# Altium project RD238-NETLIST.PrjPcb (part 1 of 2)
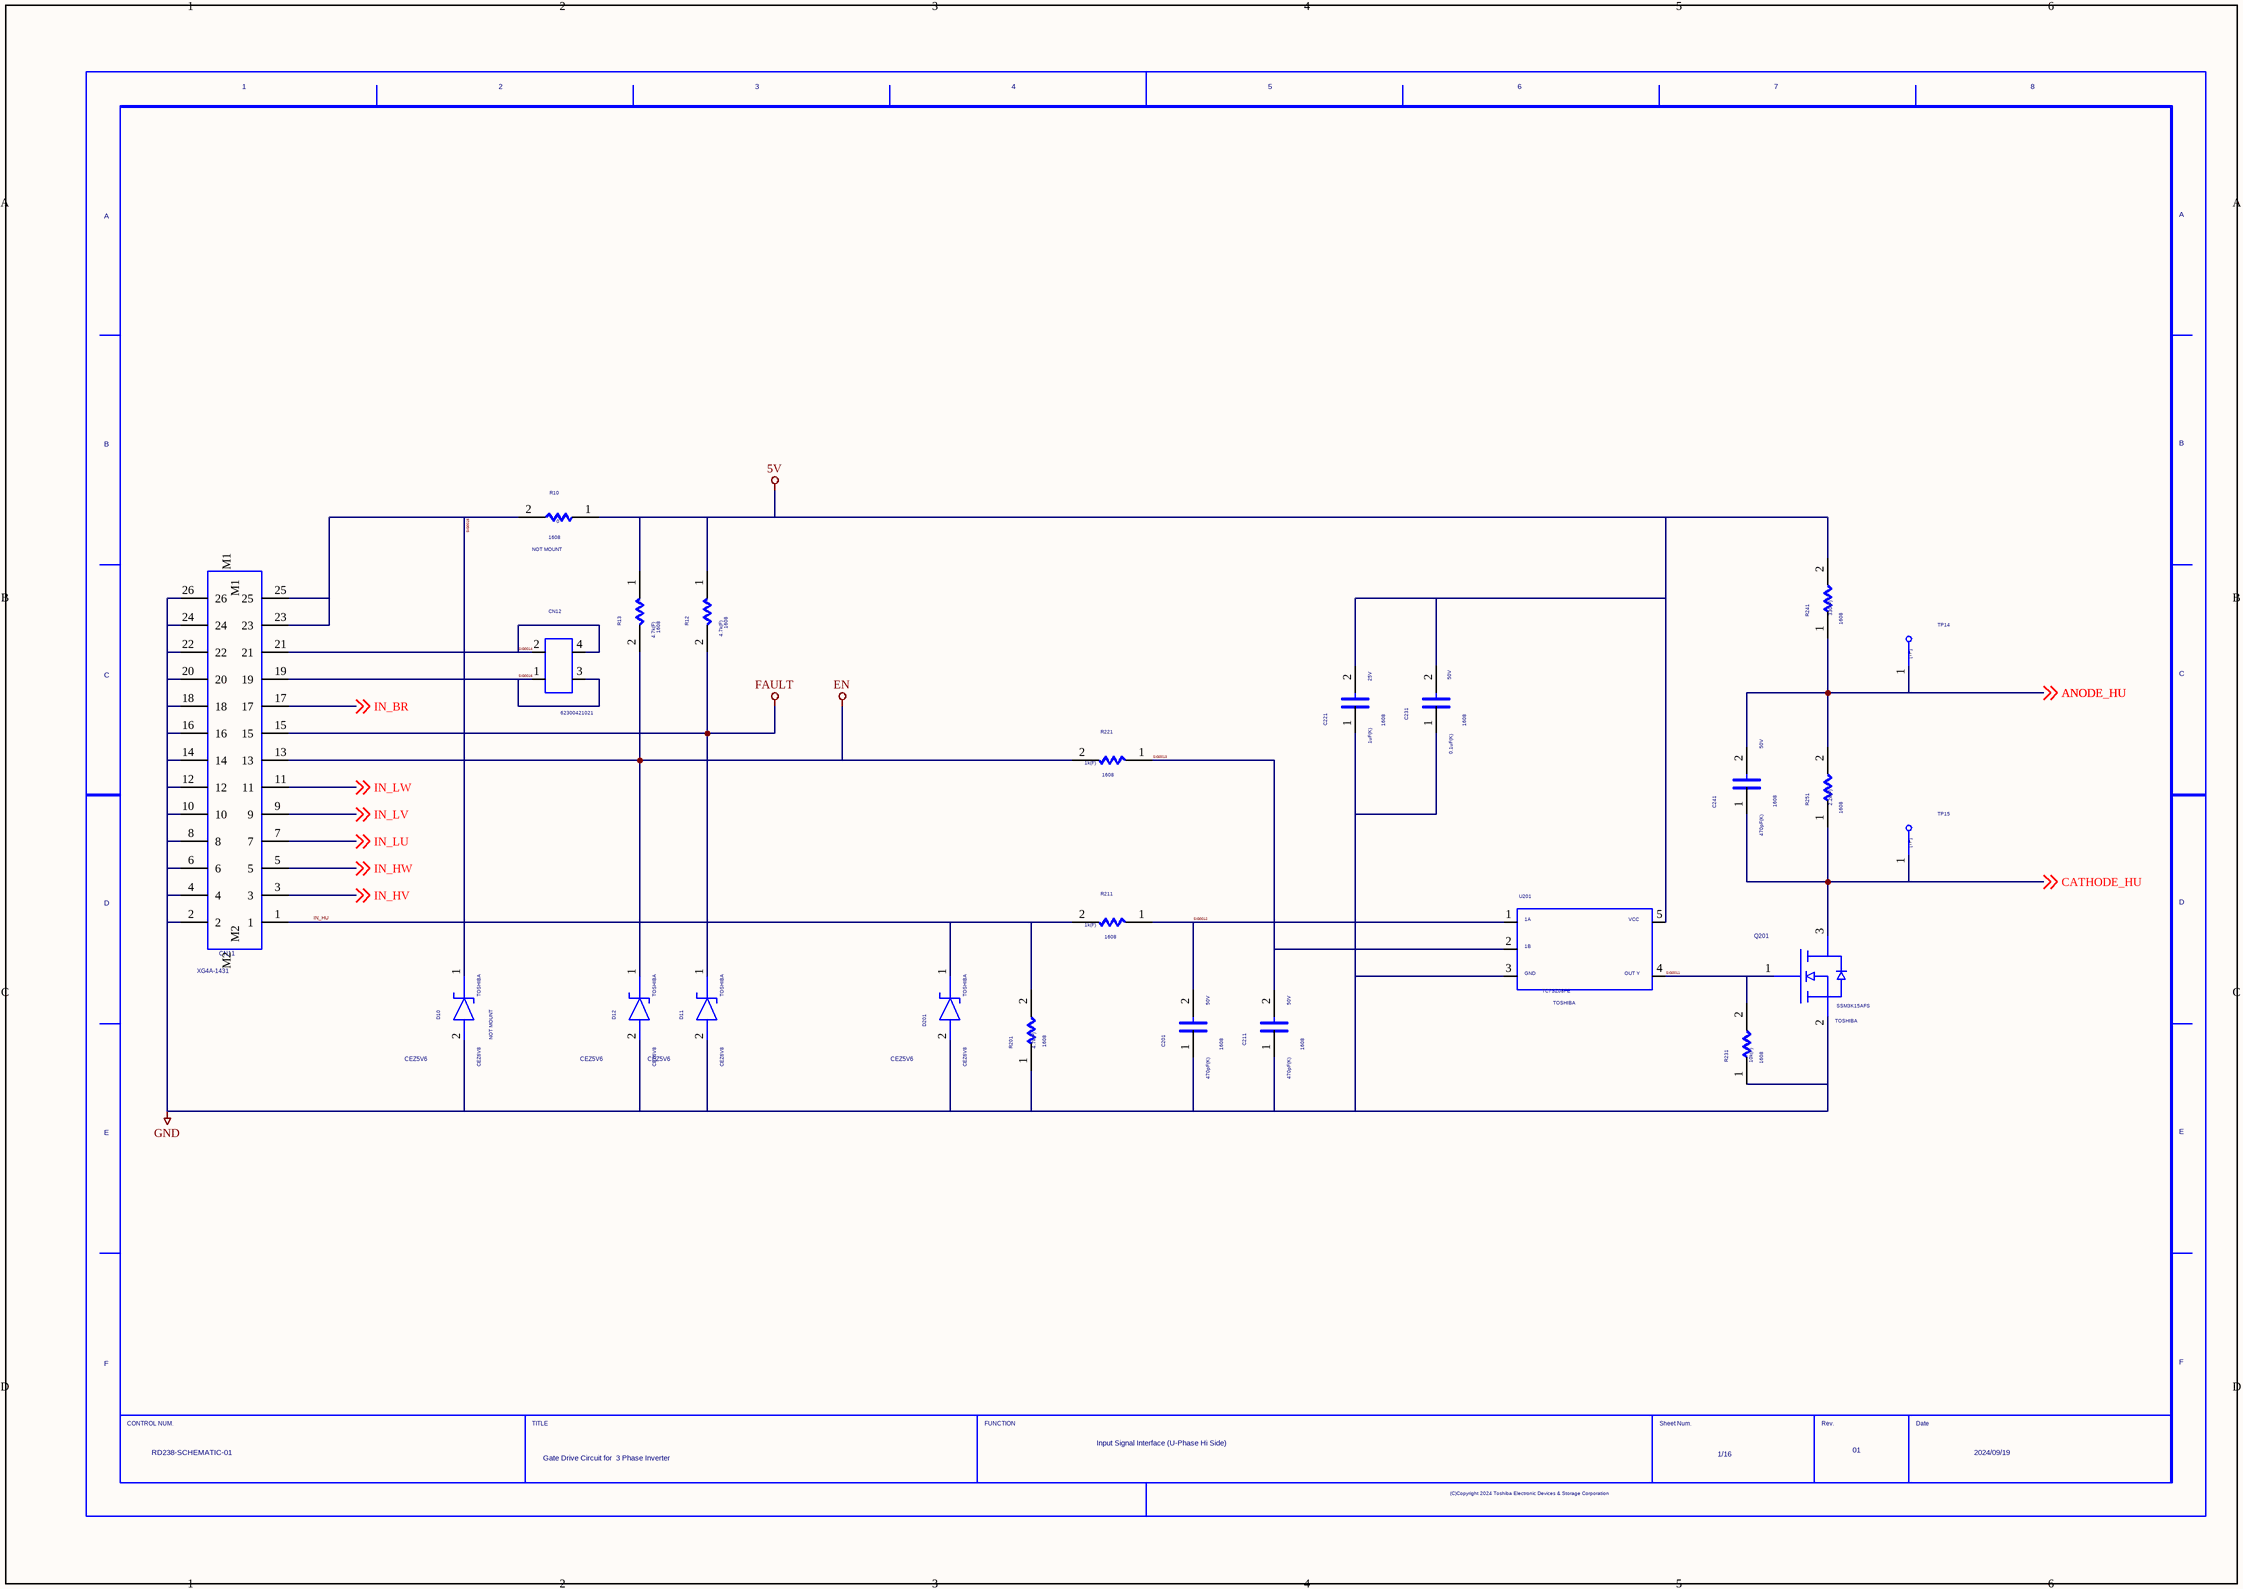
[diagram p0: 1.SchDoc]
16 sheets, 444 parts. Net scope: global (net labels, ports and power ports of the same name join across sheets).
Sheets:
  1.SchDoc
  2.SchDoc
  3.SchDoc
  4.SchDoc
  5.SchDoc
  6.SchDoc
  7.SchDoc
  8.SchDoc
  9.SchDoc
  10.SchDoc
  11.SchDoc
  12.SchDoc
  13.SchDoc
  14.SchDoc
  15.SchDoc
  16.SchDoc

## Sheet 1.SchDoc
size 420 x 297 mm

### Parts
(Parts that share a designator on the sheet are numbered #1, #2 ... from top to bottom, then left to right.)
C201  VAL1: 470pF(K)  VAL2: 50V  SIZECODESMD: 1608  (hidden comment: C)
C211  VAL1: 470pF(K)  VAL2: 50V  SIZECODESMD: 1608  (hidden comment: C)
C221  VAL1: 1uF(K)  VAL2: 25V  SIZECODESMD: 1608  (hidden comment: C)
C231  VAL1: 0.1uF(K)  VAL2: 50V  SIZECODESMD: 1608  (hidden comment: C)
C241  VAL1: 470pF(K)  VAL2: 50V  SIZECODESMD: 1608  (hidden comment: C)
CN11  XG4A-1431
CN12  VAL3: 62300421021  (hidden comment: TCR1HF50B)
D10  CEZ5V6  NOTMOUNT: NOT MOUNT  USERCOMPTEXT3: TOSHIBA  VAL3: CEZ6V8
D11  CEZ5V6  USERCOMPTEXT3: TOSHIBA  VAL3: CEZ6V8
D12  CEZ5V6  USERCOMPTEXT3: TOSHIBA  VAL3: CEZ6V8
D201  CEZ5V6  USERCOMPTEXT3: TOSHIBA  VAL3: CEZ6V8
Q201  USERCOMPTEXT3: TOSHIBA  VAL3: SSM3K15AFS  (hidden comment: SSM3K318R)
R10  NOTMOUNT: NOT MOUNT  VAL1: 0  SIZECODESMD: 1608  (hidden comment: R)
R12  VAL1: 4.7k(F)  SIZECODESMD: 1608  (hidden comment: R)
R13  VAL1: 4.7k(F)  SIZECODESMD: 1608  (hidden comment: R)
R201  VAL1: 4.7k(F)  SIZECODESMD: 1608  (hidden comment: R)
R211  VAL1: 1k(F)  SIZECODESMD: 1608  (hidden comment: R)
R221  VAL1: 1k(F)  SIZECODESMD: 1608  (hidden comment: R)
R231  VAL1: 10k(F)  SIZECODESMD: 1608  (hidden comment: R)
R241  VAL1: 330(F)  SIZECODESMD: 1608  (hidden comment: R)
R251  VAL1: 2.2k(F)  SIZECODESMD: 1608  (hidden comment: R)
TP14  TP  (value not drawn)
TP15  TP  (value not drawn)
U201  USERCOMPTEXT3: TOSHIBA  (hidden comment: TCR1HF50B)
U?#1  DATE: 2024/09/19  DRAWINGNUMBER: RD238-SCHEMATIC-01  TITLE: Gate Drive Circuit for / 3 Phase Inverter  FUNCTION: Input Signal Interface / (U-Phase Hi Side)  SHEETNUMBER: 1/16  REVISION: 01  (hidden comment: WAKU_DEF100)

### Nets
5V: C221.2 C231.2 R10.1 R12.1 R13.1 R241.2 U201.5
EN: CN11.13 D12.1(CATHODE) R13.2 R221.2
FAULT: CN11.15 D11.1(CATHODE) R12.2
GND: C201.1 C211.1 C221.1 C231.1 CN11.2 CN11.4 CN11.6 CN11.8 CN11.10 CN11.12 CN11.14 CN11.16 CN11.18 CN11.20 CN11.22 CN11.24 CN11.26 D10.2(ANODE) D11.2(ANODE) D12.2(ANODE) D201.2(ANODE) Q201.2(S) R201.1 R231.1 U201.3
ANODE_HU: C241.2 R241.1 R251.2 TP14.1 ; off-sheet ANODE_HU
CATHODE_HU: C241.1 Q201.3(D) R251.1 TP15.1 ; off-sheet CATHODE_HU
IN_BR: CN11.17 ; off-sheet IN_BR
IN_HU: CN11.1 D201.1(CATHODE) R201.2 R211.2
IN_HV: CN11.3 ; off-sheet IN_HV
IN_HW: CN11.5 ; off-sheet IN_HW
IN_LU: CN11.7 ; off-sheet IN_LU
IN_LV: CN11.9 ; off-sheet IN_LV
IN_LW: CN11.11 ; off-sheet IN_LW
SIG0011: Q201.1(G) R231.2 U201.4
SIG0012: C201.2 R211.1 U201.1
SIG0013: C211.2 R221.1 U201.2
SIG0014: CN11.21 CN12.2 CN12.4
SIG0015: CN11.23 CN11.25 D10.1(CATHODE) R10.2
SIG0016: CN11.19 CN12.1 CN12.3

Not connected (* = marked no-connect by the designer): CN11 M1 M2

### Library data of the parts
C201 C211 C221 C231 C241 = C: OriginalSymbolOrigin: (2540,7620)
CN11 = XG4A_2632: MANUFACTURER: OMRON; ORDER: $pOrder; 特性1: 300V, 3A; 特性2: 14端子, 2列 x 7端子; DESCRIPTION-A: XG4A MIL Plugs with Long Locks (MIL Standards); TIME: 08:52:43; UPDATEUSER: t5459927; UPDATETIME: 14:58:17; SAVECOUNT: 9; OriginalSymbolOrigin: (5080,0); VAL3: XG4A-2632
CN12 = NTC: MANUFACTURER: toshiba; ORDER: $pOrder; 特性1: 36 V; 特性2: 150mA; DESCRIPTION-A: LDO; TIME: 08:52:33; UPDATEUSER: sptcae09; UPDATETIME: 07:55:13; SAVECOUNT: 8; COMPONENTNAME: LT8306; OriginalSymbolOrigin: (5080,12700); COMP: CN
D10-D12 D201 = CEZ5V6_D500: ORDER: $pOrder; 特性1: 5.6V; 特性2: 5mA; DESCRIPTION-A: DIODE Zener, 5.6V, 5mA, 150mW; TIME: 08:52:39; UPDATEUSER: sptcae13; SAVECOUNT: 1; OriginalSymbolOrigin: (0,-2540)
Q201 = SSM3K15AFS_Q20: ORDER: $pOrder; 特性1: 60V; 特性2: 2.5A; 特性3: RON; DESCRIPTION-A: Nch-MOSFET, 60V, 2.5A; TIME: 08:52:39; UPDATEUSER: sptcae09; UPDATETIME: 15:47:00; SAVECOUNT: 7; OriginalSymbolOrigin: (0,-2540)
R10 = R: VAL2: 1A; OriginalSymbolOrigin: (5080,5080)
R12 = R: NOTMOUNT: MOUNT; VAL2: 0.1W; OriginalSymbolOrigin: (5080,5080)
R13 = R: NOTMOUNT: MOUNT; VAL2: 0.1W; OriginalSymbolOrigin: (5080,5080); POWERMESURINGPROBE: YES
R201 = R: VAL2: 0.1W; OriginalSymbolOrigin: (5080,5080); COMP: RK73H1JTTD4701F
R211 R221 = R#1: NOTMOUNT: MOUNT; VAL2: 100mW; OriginalSymbolOrigin: (5080,5080); CaptureCellPackProp: R##1
R231 R241 R251 = R: VAL2: 0.1W; OriginalSymbolOrigin: (5080,5080); COMP: RK73H1JTTD2400F
TP14 TP15 = TP_Dup1: TIME: 16:12:21; UPDATEUSER: fukuda-y; UPDATETIME: 16:18:11; SAVECOUNT: 2; SAVEAREA0: -242,-92,12810,7836; OriginalSymbolOrigin: (0,7620); VAL1: SWB; COMP: TEST_PAD
U201 = TC7SZ08FE: ORDER: $pOrder; 特性1: 36 V; 特性2: 150mA; DESCRIPTION-A: LDO; TIME: 08:52:33; UPDATEUSER: sptcae09; UPDATETIME: 15:19:01; SAVECOUNT: 8; COMP: U; OriginalSymbolOrigin: (2540,17780)
U?#1 = WAKU_DEF100: SAVEAREA0: 185750,-43960,448537,75779; TIME: 14:30:25; UPDATEUSER: t5459927; UPDATETIME: 10:22:17; SAVECOUNT: 9; OriginalSymbolOrigin: (10160,284480); SHTSAVECOUNT: 30

## Sheet 2.SchDoc
size 420 x 297 mm
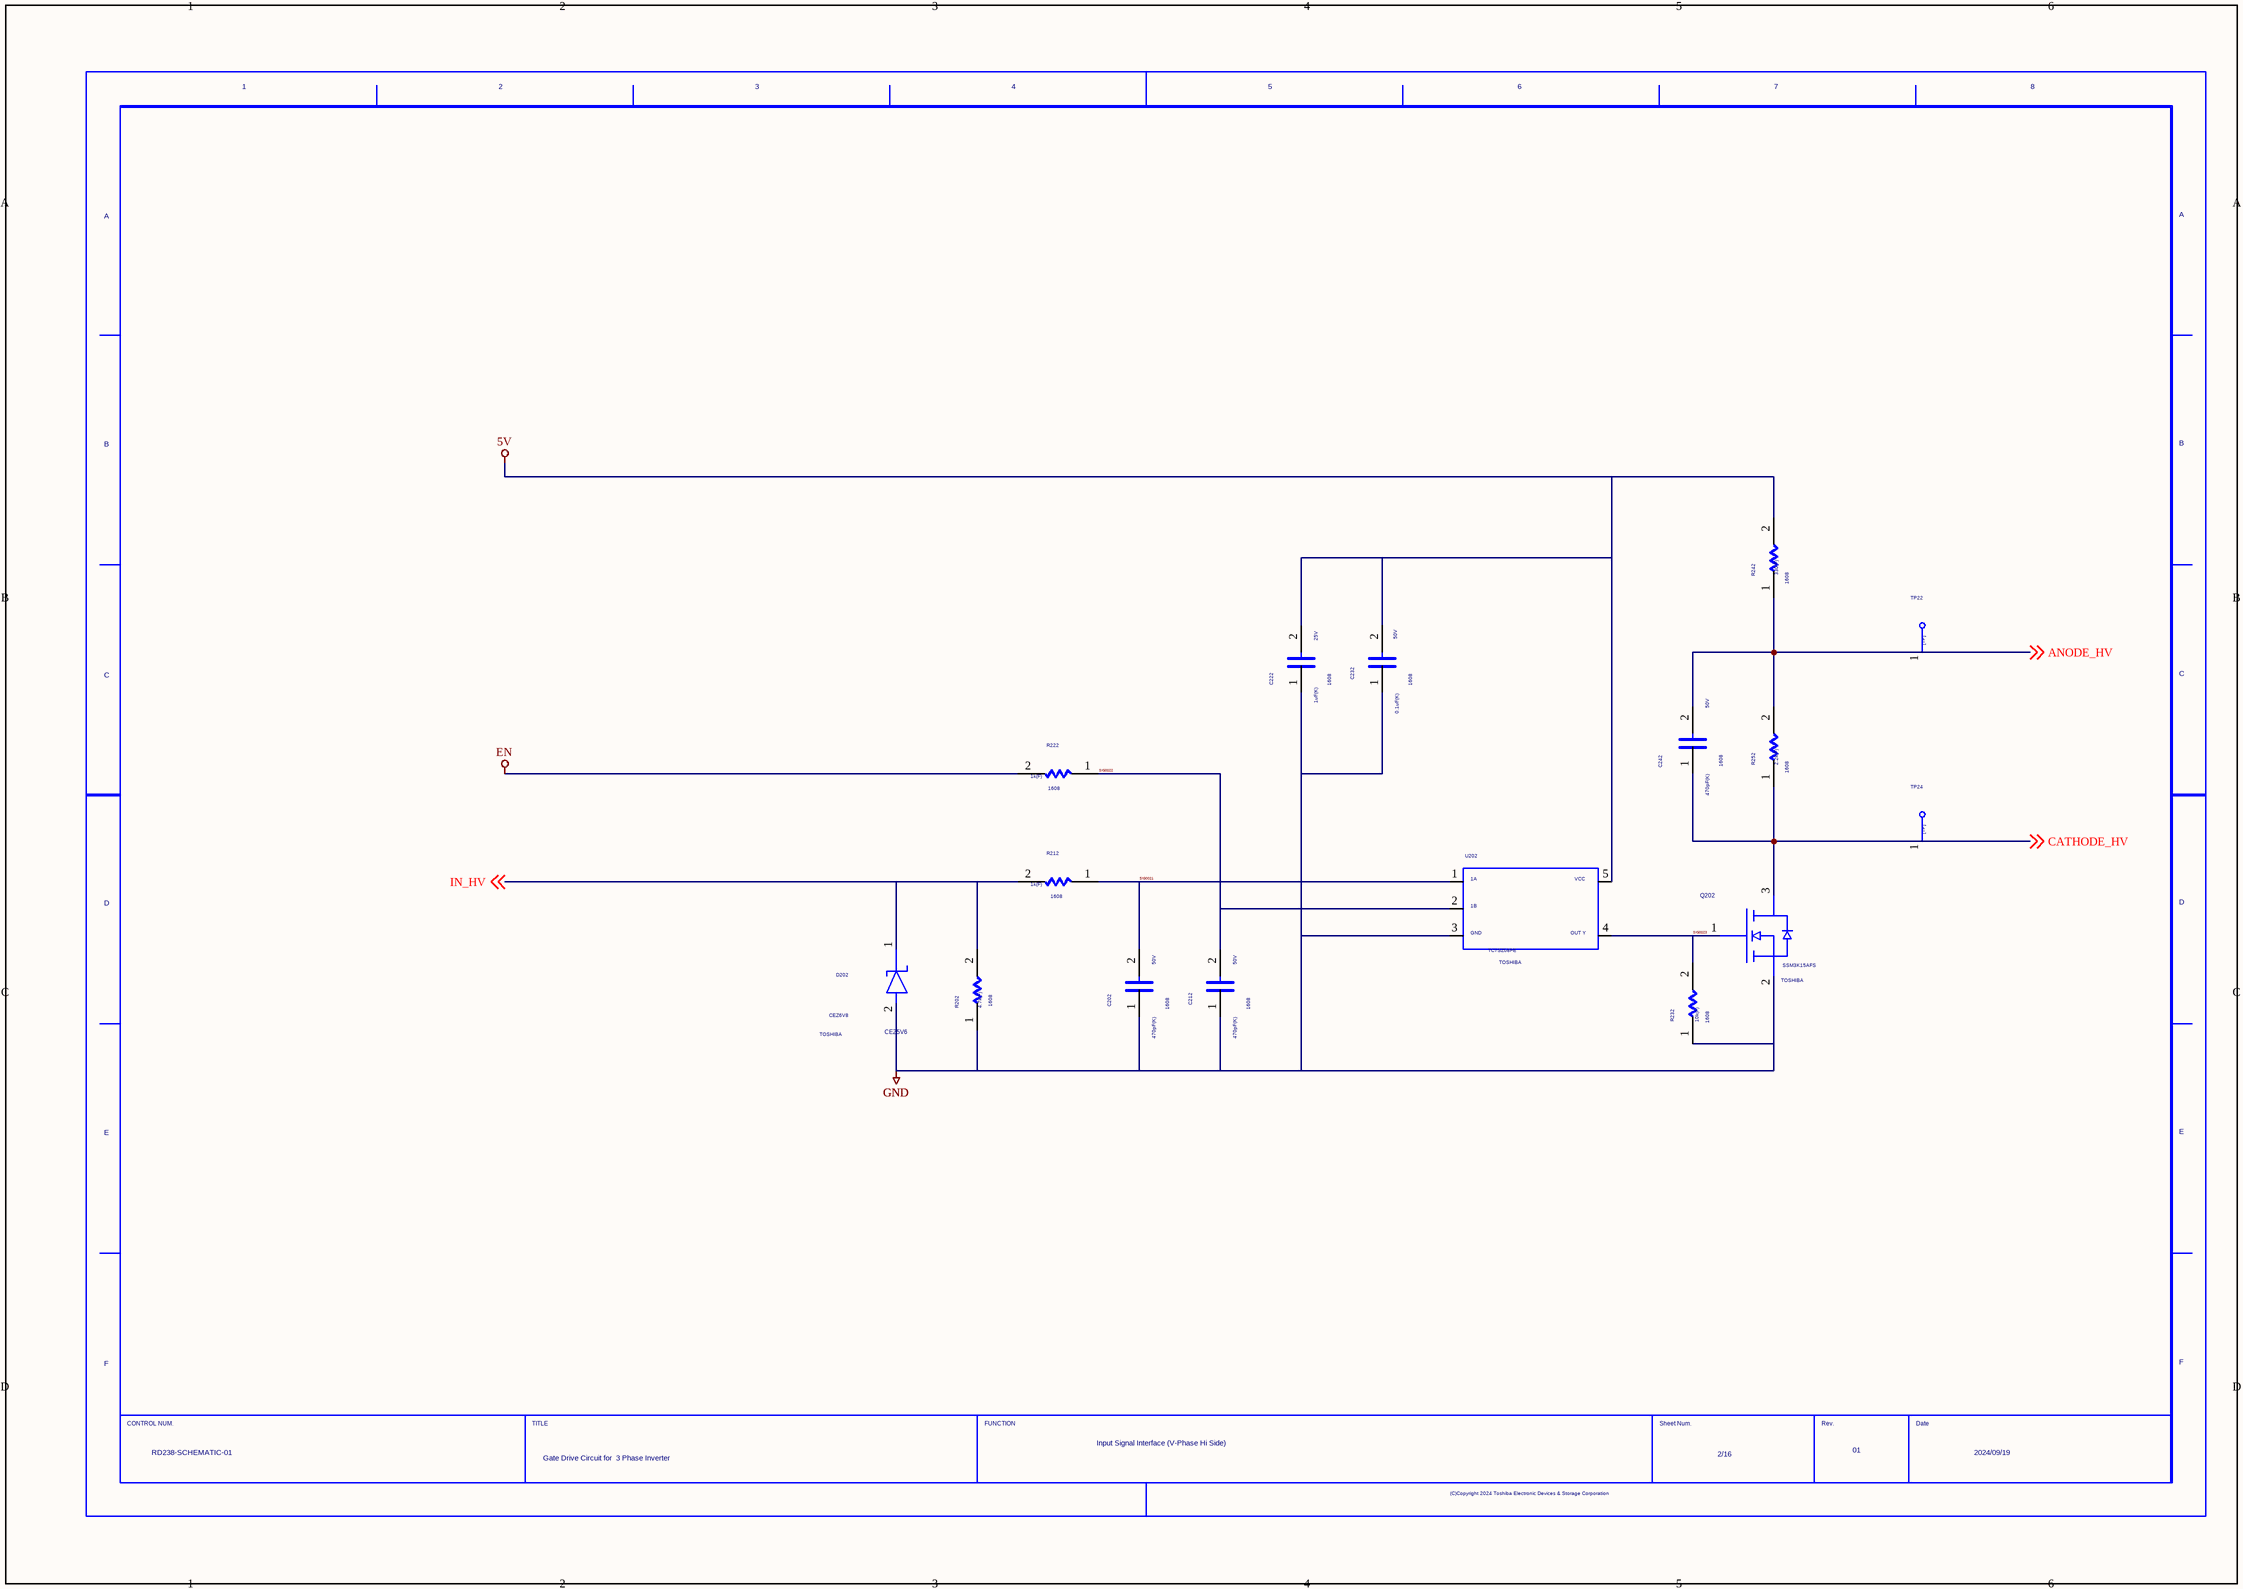
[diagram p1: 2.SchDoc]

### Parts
(Parts that share a designator on the sheet are numbered #1, #2 ... from top to bottom, then left to right.)
C202  VAL1: 470pF(K)  VAL2: 50V  SIZECODESMD: 1608  (hidden comment: C)
C212  VAL1: 470pF(K)  VAL2: 50V  SIZECODESMD: 1608  (hidden comment: C)
C222  VAL1: 1uF(K)  VAL2: 25V  SIZECODESMD: 1608  (hidden comment: C)
C232  VAL1: 0.1uF(K)  VAL2: 50V  SIZECODESMD: 1608  (hidden comment: C)
C242  VAL1: 470pF(K)  VAL2: 50V  SIZECODESMD: 1608  (hidden comment: C)
D202  CEZ5V6  USERCOMPTEXT3: TOSHIBA  VAL3: CEZ6V8
Q202  USERCOMPTEXT3: TOSHIBA  VAL3: SSM3K15AFS  (hidden comment: SSM3K318R)
R202  VAL1: 4.7k(F)  SIZECODESMD: 1608  (hidden comment: R)
R212  VAL1: 1k(F)  SIZECODESMD: 1608  (hidden comment: R)
R222  VAL1: 1k(F)  SIZECODESMD: 1608  (hidden comment: R)
R232  VAL1: 10k(F)  SIZECODESMD: 1608  (hidden comment: R)
R242  VAL1: 330(F)  SIZECODESMD: 1608  (hidden comment: R)
R252  VAL1: 2.2k(F)  SIZECODESMD: 1608  (hidden comment: R)
TP22  TP  (value not drawn)
TP24  TP  (value not drawn)
U202  USERCOMPTEXT3: TOSHIBA  (hidden comment: TCR1HF50B)
U?#2  DATE: 2024/09/19  DRAWINGNUMBER: RD238-SCHEMATIC-01  TITLE: Gate Drive Circuit for / 3 Phase Inverter  FUNCTION: Input Signal Interface / (V-Phase Hi Side)  SHEETNUMBER: 2/16  REVISION: 01  (hidden comment: WAKU_DEF100)

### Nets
5V: C222.2 C232.2 R242.2 U202.5
EN: R222.2
GND: C202.1 C212.1 C222.1 C232.1 D202.2(ANODE) Q202.2(S) R202.1 R232.1 U202.3
ANODE_HV: C242.2 R242.1 R252.2 TP22.1 ; off-sheet ANODE_HV
CATHODE_HV: C242.1 Q202.3(D) R252.1 TP24.1 ; off-sheet CATHODE_HV
IN_HV: D202.1(CATHODE) R202.2 R212.2 ; off-sheet IN_HV
SIG0021: C202.2 R212.1 U202.1
SIG0022: C212.2 R222.1 U202.2
SIG0023: Q202.1(G) R232.2 U202.4

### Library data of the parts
C202 C212 C222 C232 C242 = C: OriginalSymbolOrigin: (2540,7620)
D202 = CEZ5V6_D500: ORDER: $pOrder; COMP: CEZ6V8_D201; 特性1: 5.6V; 特性2: 5mA; DESCRIPTION-A: DIODE Zener, 5.6V, 5mA, 150mW; TIME: 08:52:39; UPDATEUSER: sptcae13; SAVECOUNT: 1; OriginalSymbolOrigin: (0,-2540)
Q202 = SSM3K15AFS_Q20: as Q201 on sheet 1
R202 = R: as R201 on sheet 1
R212 R222 = R#1: as R211 on sheet 1
R232 R242 R252 = R: as R231 on sheet 1
TP22 TP24 = TP: TIME: 16:12:21; UPDATEUSER: fukuda-y; UPDATETIME: 16:18:11; SAVECOUNT: 2; SAVEAREA0: -242,-92,12810,7836; OriginalSymbolOrigin: (0,7620)
U202 = TC7SZ08FE: as U201 on sheet 1
U?#2 = WAKU_DEF100: SAVEAREA0: 185750,-43960,448537,75779; TIME: 14:30:25; UPDATEUSER: t5459927; UPDATETIME: 10:22:17; SAVECOUNT: 9; OriginalSymbolOrigin: (10160,284480); SHTSAVECOUNT: 20

## Sheet 3.SchDoc
size 420 x 297 mm
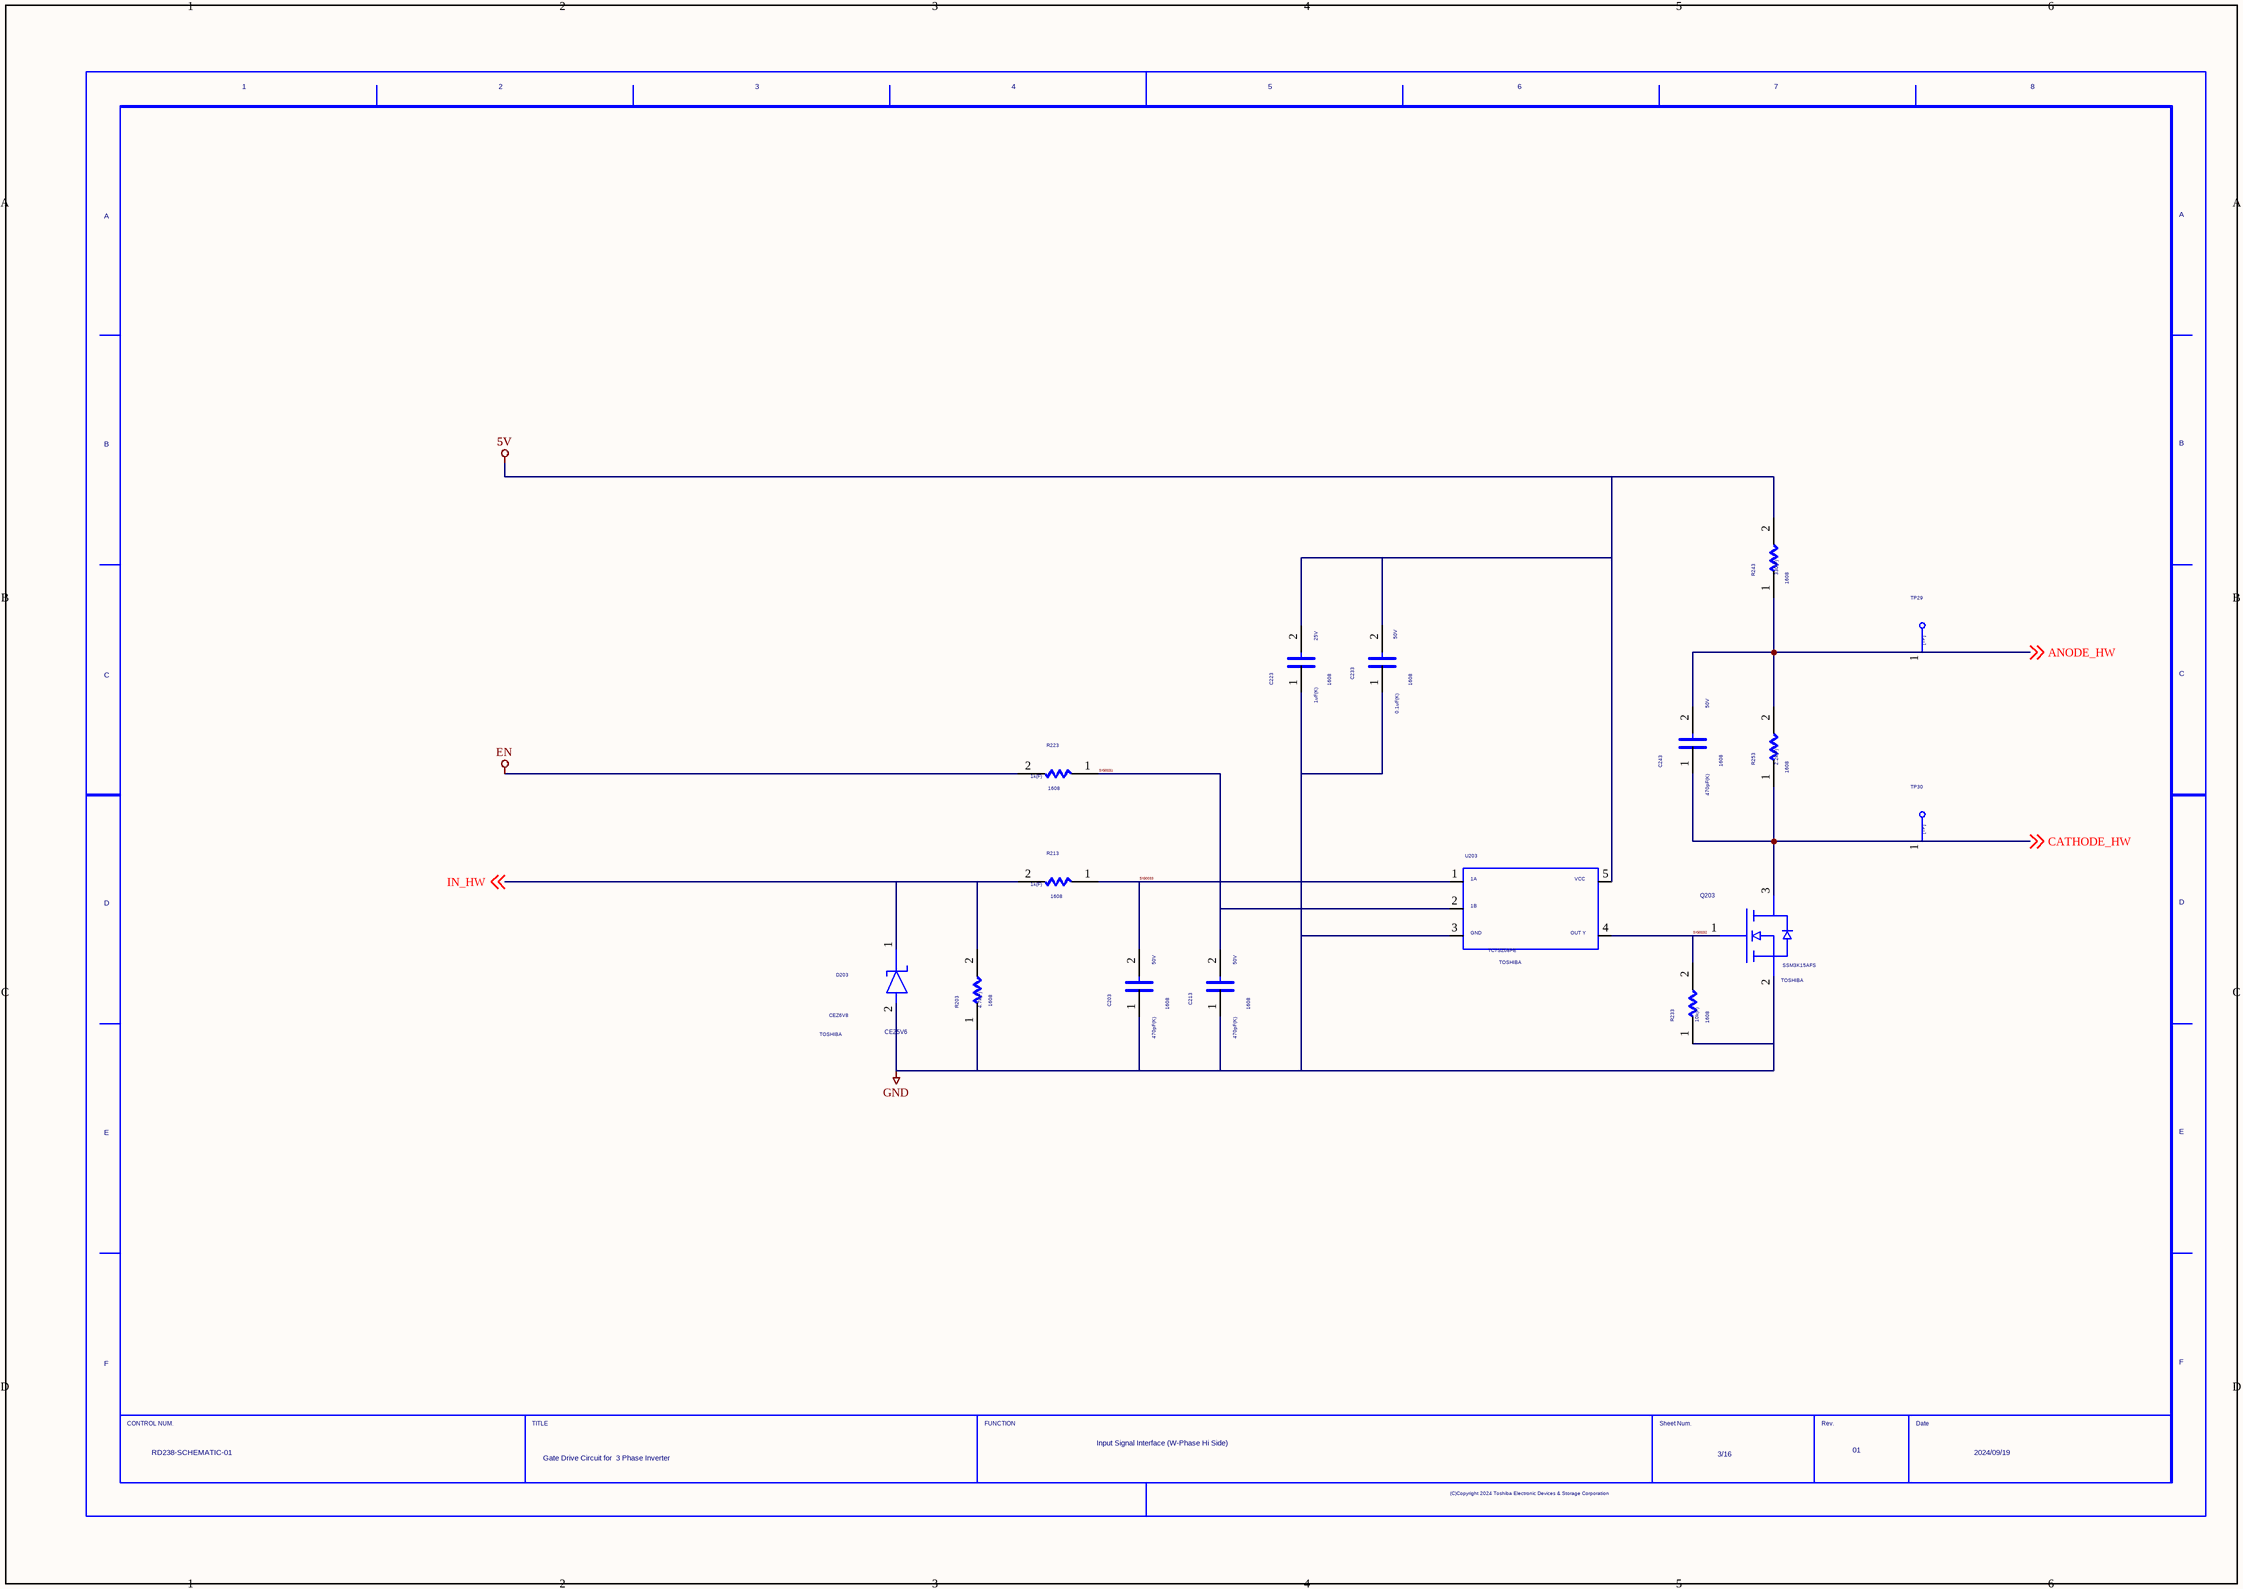
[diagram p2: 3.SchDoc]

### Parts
(Parts that share a designator on the sheet are numbered #1, #2 ... from top to bottom, then left to right.)
C203  VAL1: 470pF(K)  VAL2: 50V  SIZECODESMD: 1608  (hidden comment: C)
C213  VAL1: 470pF(K)  VAL2: 50V  SIZECODESMD: 1608  (hidden comment: C)
C223  VAL1: 1uF(K)  VAL2: 25V  SIZECODESMD: 1608  (hidden comment: C)
C233  VAL1: 0.1uF(K)  VAL2: 50V  SIZECODESMD: 1608  (hidden comment: C)
C243  VAL1: 470pF(K)  VAL2: 50V  SIZECODESMD: 1608  (hidden comment: C)
D203  CEZ5V6  USERCOMPTEXT3: TOSHIBA  VAL3: CEZ6V8
Q203  USERCOMPTEXT3: TOSHIBA  VAL3: SSM3K15AFS  (hidden comment: SSM3K318R)
R203  VAL1: 4.7k(F)  SIZECODESMD: 1608  (hidden comment: R)
R213  VAL1: 1k(F)  SIZECODESMD: 1608  (hidden comment: R)
R223  VAL1: 1k(F)  SIZECODESMD: 1608  (hidden comment: R)
R233  VAL1: 10k(F)  SIZECODESMD: 1608  (hidden comment: R)
R243  VAL1: 330(F)  SIZECODESMD: 1608  (hidden comment: R)
R253  VAL1: 2.2k(F)  SIZECODESMD: 1608  (hidden comment: R)
TP29  TP  (value not drawn)
TP30  TP  (value not drawn)
U203  USERCOMPTEXT3: TOSHIBA  (hidden comment: TCR1HF50B)
U?#3  DATE: 2024/09/19  DRAWINGNUMBER: RD238-SCHEMATIC-01  TITLE: Gate Drive Circuit for / 3 Phase Inverter  FUNCTION: Input Signal Interface / (W-Phase Hi Side)  SHEETNUMBER: 3/16  REVISION: 01  (hidden comment: WAKU_DEF100)

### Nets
5V: C223.2 C233.2 R243.2 U203.5
EN: R223.2
GND: C203.1 C213.1 C223.1 C233.1 D203.2(ANODE) Q203.2(S) R203.1 R233.1 U203.3
ANODE_HW: C243.2 R243.1 R253.2 TP29.1 ; off-sheet ANODE_HW
CATHODE_HW: C243.1 Q203.3(D) R253.1 TP30.1 ; off-sheet CATHODE_HW
IN_HW: D203.1(CATHODE) R203.2 R213.2 ; off-sheet IN_HW
SIG0031: C213.2 R223.1 U203.2
SIG0032: Q203.1(G) R233.2 U203.4
SIG0033: C203.2 R213.1 U203.1

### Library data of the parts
C203 C213 C223 C233 C243 = C: OriginalSymbolOrigin: (2540,7620)
D203 = CEZ5V6_D500: as D202 on sheet 2
Q203 = SSM3K15AFS_Q20: as Q201 on sheet 1
R203 = R: as R201 on sheet 1
R213 R223 = R#1: as R211 on sheet 1
R233 R243 R253 = R: as R231 on sheet 1
TP29 TP30 = TP: as TP22 on sheet 2
U203 = TC7SZ08FE: as U201 on sheet 1
U?#3 = WAKU_DEF100: SAVEAREA0: 185750,-43960,448537,75779; TIME: 14:30:25; UPDATEUSER: t5459927; UPDATETIME: 10:22:17; SAVECOUNT: 9; OriginalSymbolOrigin: (10160,284480); SHTSAVECOUNT: 25

## Sheet 4.SchDoc
size 420 x 297 mm
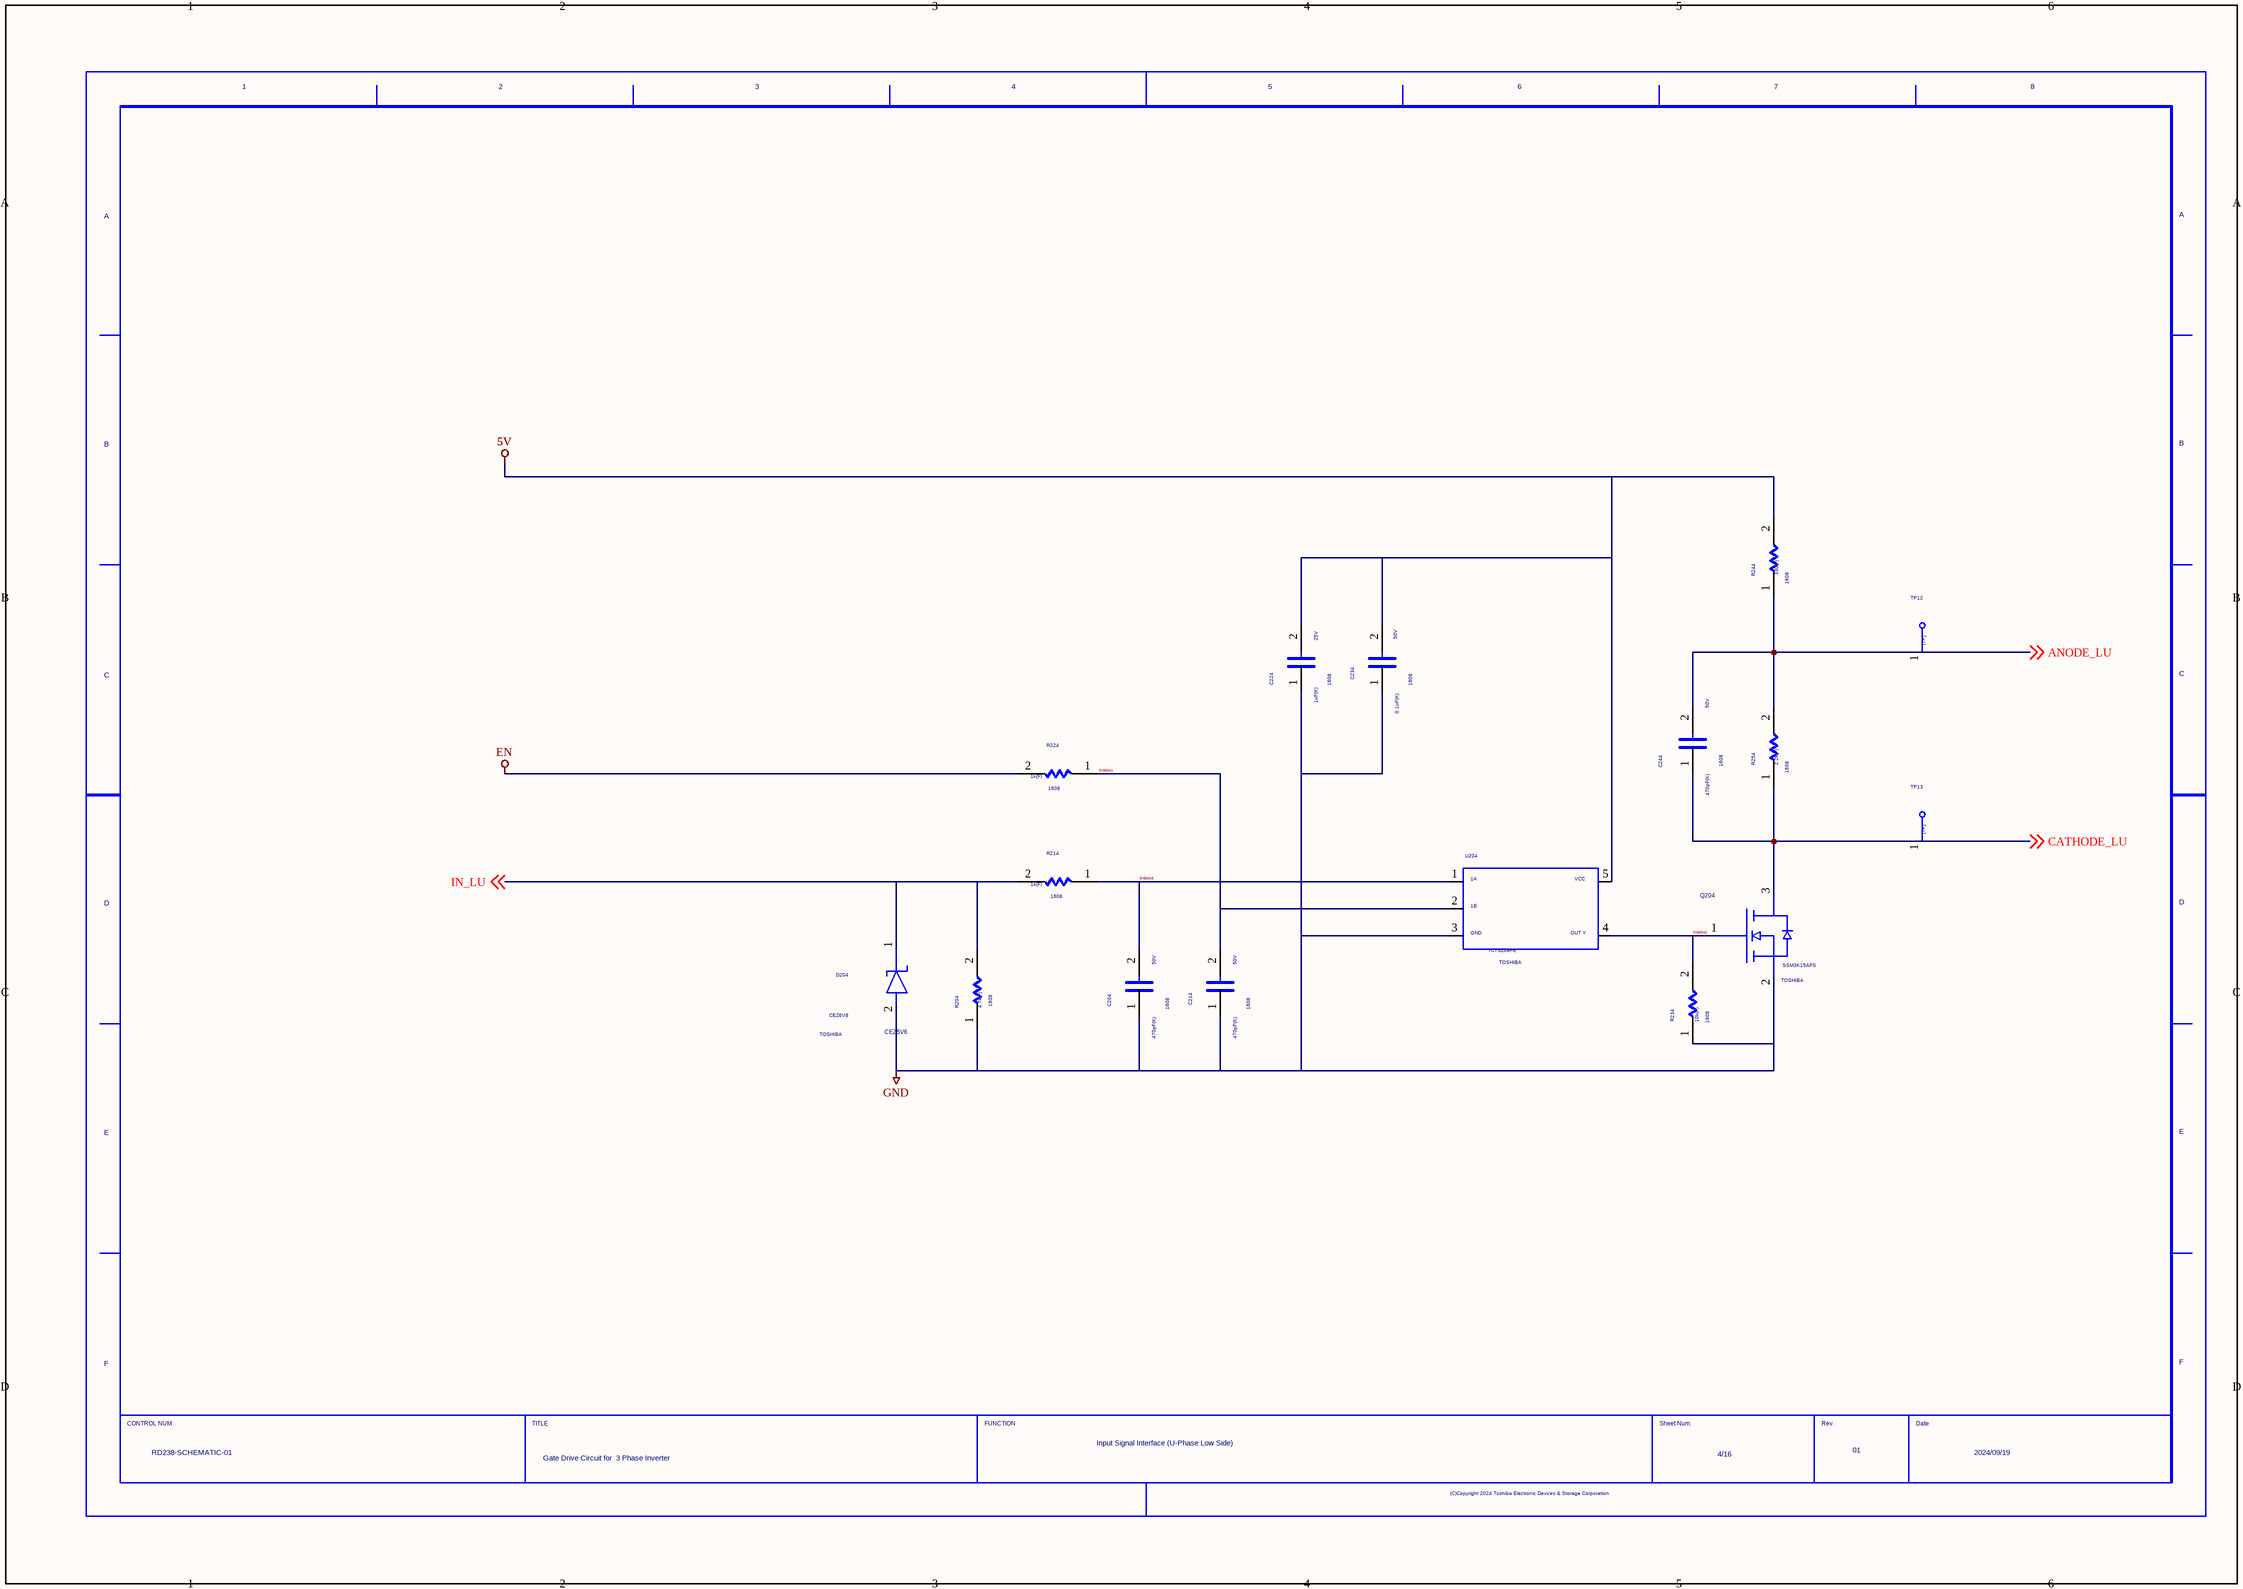
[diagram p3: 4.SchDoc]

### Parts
(Parts that share a designator on the sheet are numbered #1, #2 ... from top to bottom, then left to right.)
C204  VAL1: 470pF(K)  VAL2: 50V  SIZECODESMD: 1608  (hidden comment: C)
C214  VAL1: 470pF(K)  VAL2: 50V  SIZECODESMD: 1608  (hidden comment: C)
C224  VAL1: 1uF(K)  VAL2: 25V  SIZECODESMD: 1608  (hidden comment: C)
C234  VAL1: 0.1uF(K)  VAL2: 50V  SIZECODESMD: 1608  (hidden comment: C)
C244  VAL1: 470pF(K)  VAL2: 50V  SIZECODESMD: 1608  (hidden comment: C)
D204  CEZ5V6  USERCOMPTEXT3: TOSHIBA  VAL3: CEZ6V8
Q204  USERCOMPTEXT3: TOSHIBA  VAL3: SSM3K15AFS  (hidden comment: SSM3K318R)
R204  VAL1: 4.7k(F)  SIZECODESMD: 1608  (hidden comment: R)
R214  VAL1: 1k(F)  SIZECODESMD: 1608  (hidden comment: R)
R224  VAL1: 1k(F)  SIZECODESMD: 1608  (hidden comment: R)
R234  VAL1: 10k(F)  SIZECODESMD: 1608  (hidden comment: R)
R244  VAL1: 330(F)  SIZECODESMD: 1608  (hidden comment: R)
R254  VAL1: 2.2k(F)  SIZECODESMD: 1608  (hidden comment: R)
TP12  TP  (value not drawn)
TP13  TP  (value not drawn)
U204  USERCOMPTEXT3: TOSHIBA  (hidden comment: TCR1HF50B)
U?#4  DATE: 2024/09/19  DRAWINGNUMBER: RD238-SCHEMATIC-01  TITLE: Gate Drive Circuit for / 3 Phase Inverter  FUNCTION: Input Signal Interface / (U-Phase Low Side)  SHEETNUMBER: 4/16  REVISION: 01  (hidden comment: WAKU_DEF100)

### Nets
5V: C224.2 C234.2 R244.2 U204.5
EN: R224.2
GND: C204.1 C214.1 C224.1 C234.1 D204.2(ANODE) Q204.2(S) R204.1 R234.1 U204.3
ANODE_LU: C244.2 R244.1 R254.2 TP12.1 ; off-sheet ANODE_LU
CATHODE_LU: C244.1 Q204.3(D) R254.1 TP13.1 ; off-sheet CATHODE_LU
IN_LU: D204.1(CATHODE) R204.2 R214.2 ; off-sheet IN_LU
SIG0041: C214.2 R224.1 U204.2
SIG0042: Q204.1(G) R234.2 U204.4
SIG0043: C204.2 R214.1 U204.1

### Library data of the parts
C204 C214 C224 C234 C244 = C: OriginalSymbolOrigin: (2540,7620)
D204 = CEZ5V6_D500: as D202 on sheet 2
Q204 = SSM3K15AFS_Q20: as Q201 on sheet 1
R204 = R: as R201 on sheet 1
R214 R224 = R#1: as R211 on sheet 1
R234 R244 R254 = R: as R231 on sheet 1
TP12 TP13 = TP: as TP22 on sheet 2
U204 = TC7SZ08FE: as U201 on sheet 1
U?#4 = WAKU_DEF100: SAVEAREA0: 185750,-43960,448537,75779; TIME: 14:30:25; UPDATEUSER: t5459927; UPDATETIME: 10:22:17; SAVECOUNT: 9; OriginalSymbolOrigin: (10160,284480); SHTSAVECOUNT: 24

## Sheet 5.SchDoc
size 420 x 297 mm
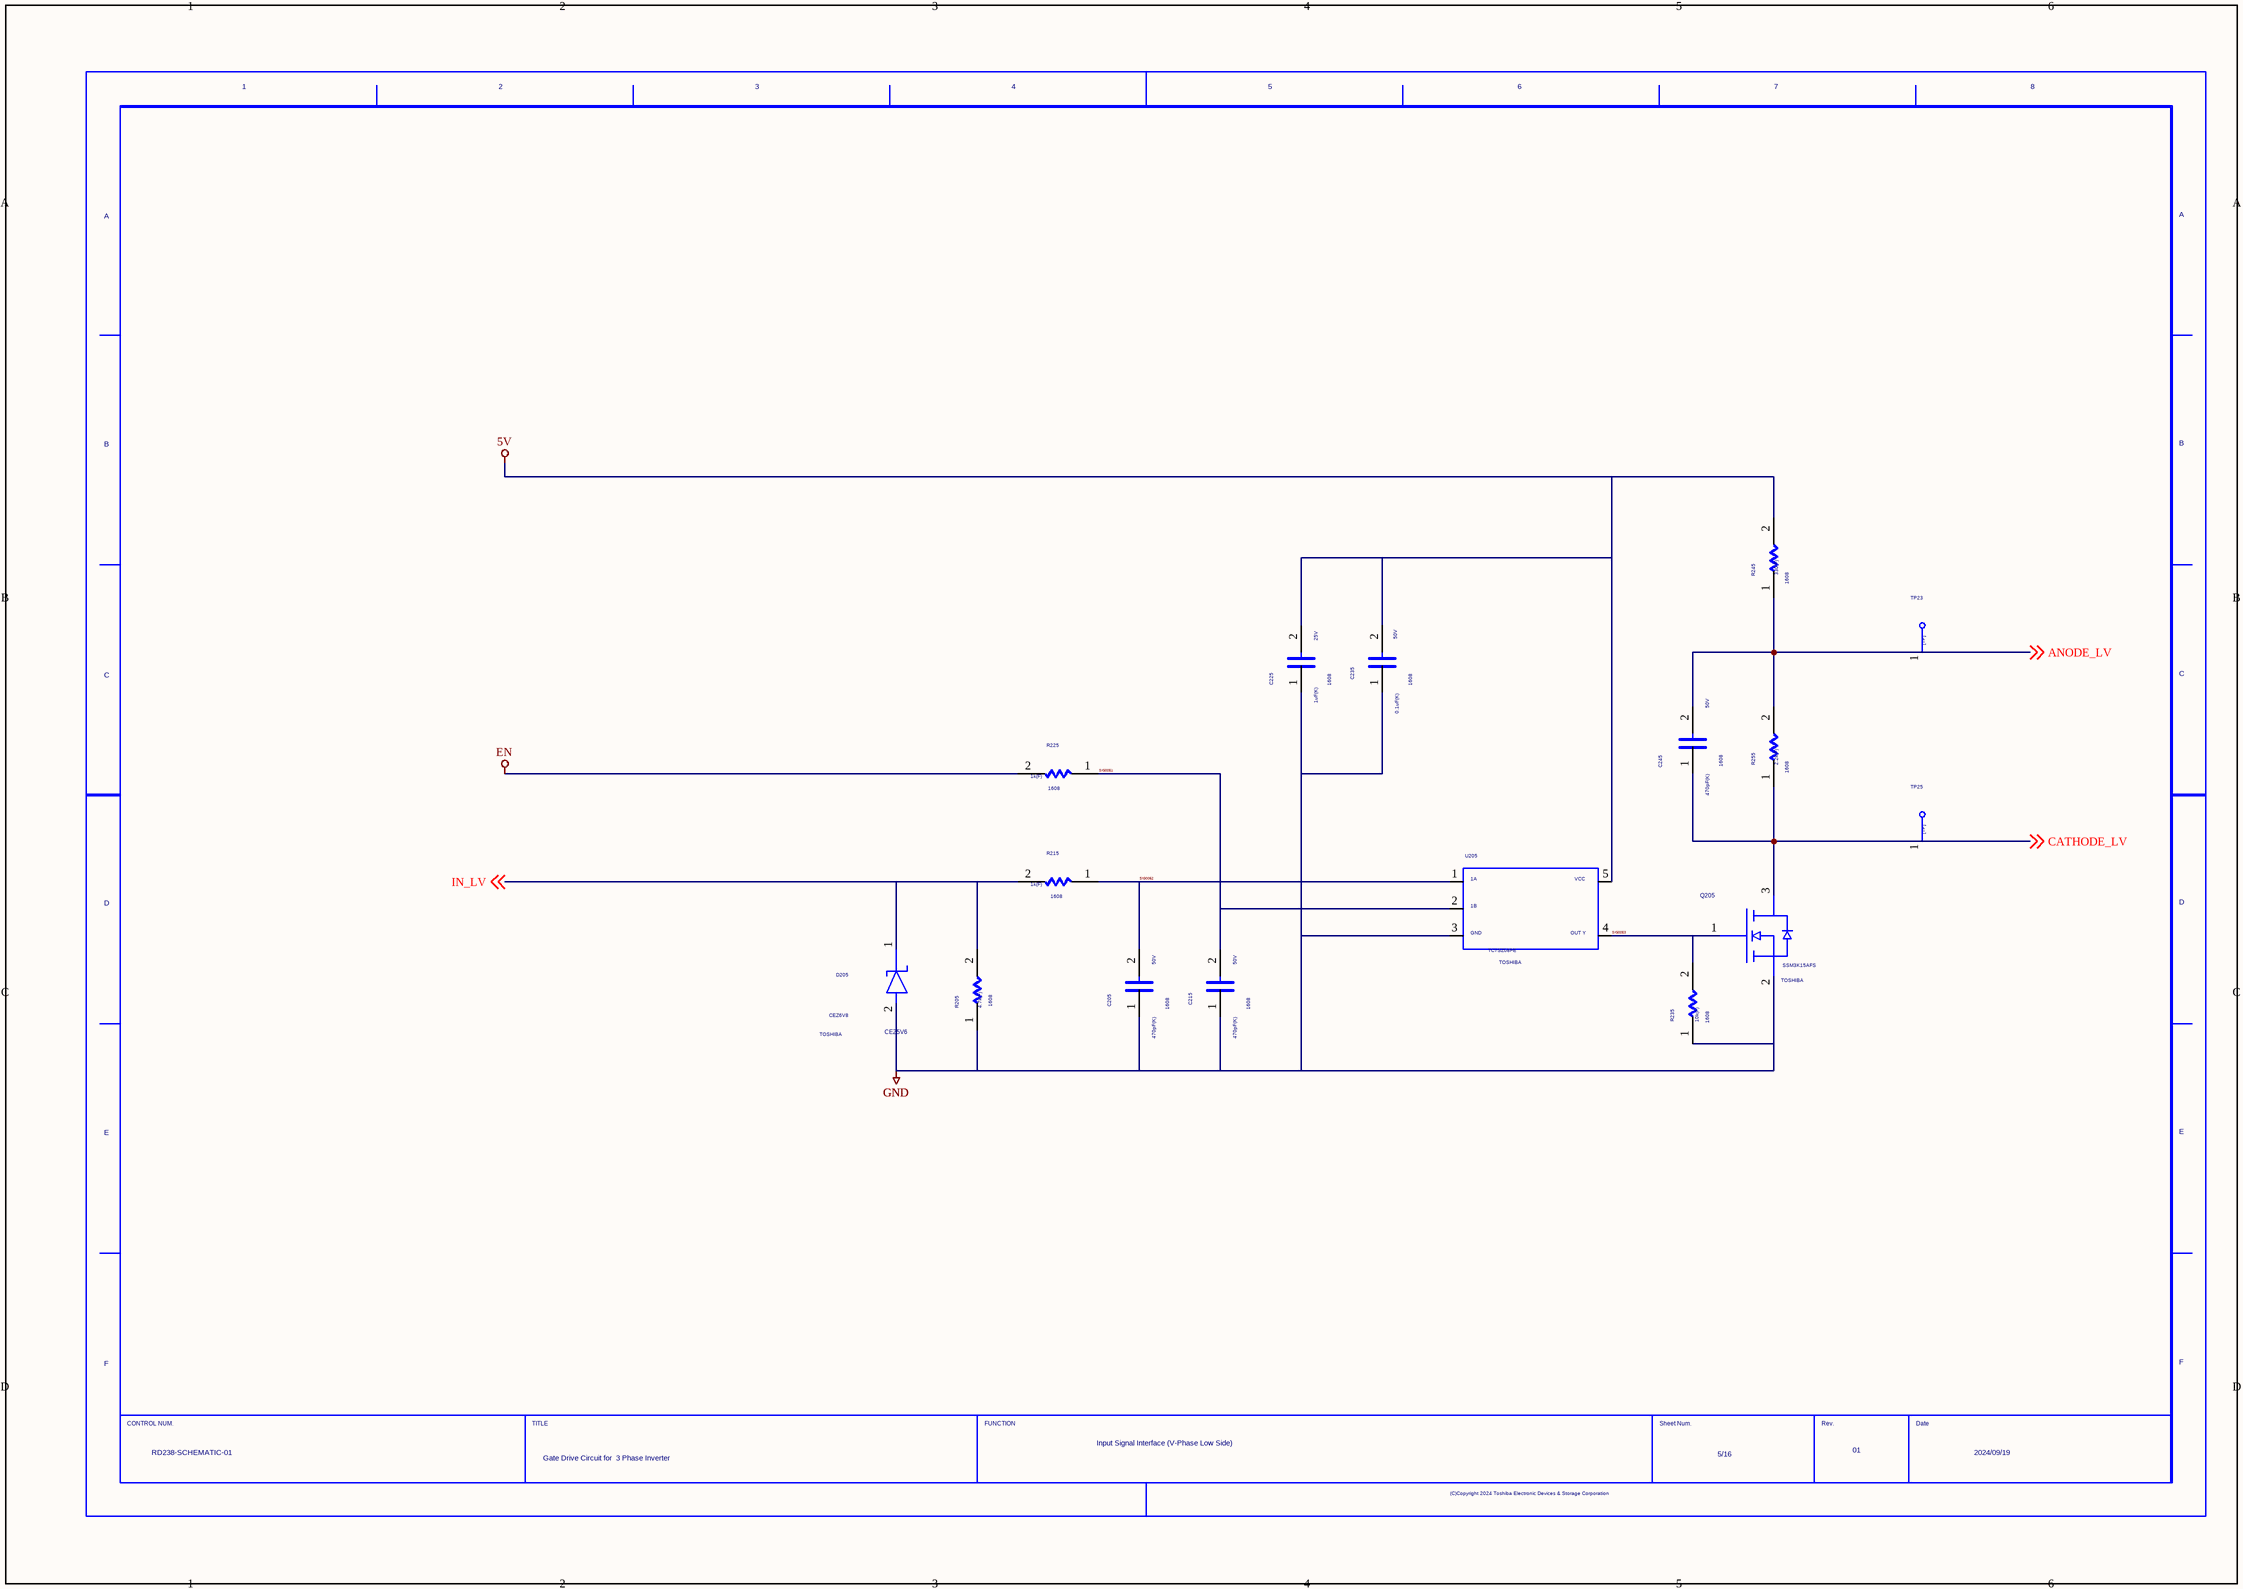
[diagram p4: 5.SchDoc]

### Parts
(Parts that share a designator on the sheet are numbered #1, #2 ... from top to bottom, then left to right.)
C205  VAL1: 470pF(K)  VAL2: 50V  SIZECODESMD: 1608  (hidden comment: C)
C215  VAL1: 470pF(K)  VAL2: 50V  SIZECODESMD: 1608  (hidden comment: C)
C225  VAL1: 1uF(K)  VAL2: 25V  SIZECODESMD: 1608  (hidden comment: C)
C235  VAL1: 0.1uF(K)  VAL2: 50V  SIZECODESMD: 1608  (hidden comment: C)
C245  VAL1: 470pF(K)  VAL2: 50V  SIZECODESMD: 1608  (hidden comment: C)
D205  CEZ5V6  USERCOMPTEXT3: TOSHIBA  VAL3: CEZ6V8
Q205  USERCOMPTEXT3: TOSHIBA  VAL3: SSM3K15AFS  (hidden comment: SSM3K318R)
R205  VAL1: 4.7k(F)  SIZECODESMD: 1608  (hidden comment: R)
R215  VAL1: 1k(F)  SIZECODESMD: 1608  (hidden comment: R)
R225  VAL1: 1k(F)  SIZECODESMD: 1608  (hidden comment: R)
R235  VAL1: 10k(F)  SIZECODESMD: 1608  (hidden comment: R)
R245  VAL1: 330(F)  SIZECODESMD: 1608  (hidden comment: R)
R255  VAL1: 2.2k(F)  SIZECODESMD: 1608  (hidden comment: R)
TP23  TP  (value not drawn)
TP25  TP  (value not drawn)
U205  USERCOMPTEXT3: TOSHIBA  (hidden comment: TCR1HF50B)
U?#5  DATE: 2024/09/19  DRAWINGNUMBER: RD238-SCHEMATIC-01  TITLE: Gate Drive Circuit for / 3 Phase Inverter  FUNCTION: Input Signal Interface / (V-Phase Low Side)  SHEETNUMBER: 5/16  REVISION: 01  (hidden comment: WAKU_DEF100)

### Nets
5V: C225.2 C235.2 R245.2 U205.5
EN: R225.2
GND: C205.1 C215.1 C225.1 C235.1 D205.2(ANODE) Q205.2(S) R205.1 R235.1 U205.3
ANODE_LV: C245.2 R245.1 R255.2 TP23.1 ; off-sheet ANODE_LV
CATHODE_LV: C245.1 Q205.3(D) R255.1 TP25.1 ; off-sheet CATHODE_LV
IN_LV: D205.1(CATHODE) R205.2 R215.2 ; off-sheet IN_LV
SIG0051: C215.2 R225.1 U205.2
SIG0052: C205.2 R215.1 U205.1
SIG0053: Q205.1(G) R235.2 U205.4

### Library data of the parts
C205 C215 C225 C235 C245 = C: OriginalSymbolOrigin: (2540,7620)
D205 = CEZ5V6_D500: as D202 on sheet 2
Q205 = SSM3K15AFS_Q20: as Q201 on sheet 1
R205 = R: as R201 on sheet 1
R215 R225 = R#1: as R211 on sheet 1
R235 R245 R255 = R: as R231 on sheet 1
TP23 TP25 = TP: as TP22 on sheet 2
U205 = TC7SZ08FE: as U201 on sheet 1
U?#5 = WAKU_DEF100: SAVEAREA0: 185750,-43960,448537,75779; TIME: 14:30:25; UPDATEUSER: t5459927; UPDATETIME: 10:22:17; SAVECOUNT: 9; OriginalSymbolOrigin: (10160,284480); SHTSAVECOUNT: 23

## Sheet 6.SchDoc
size 420 x 297 mm
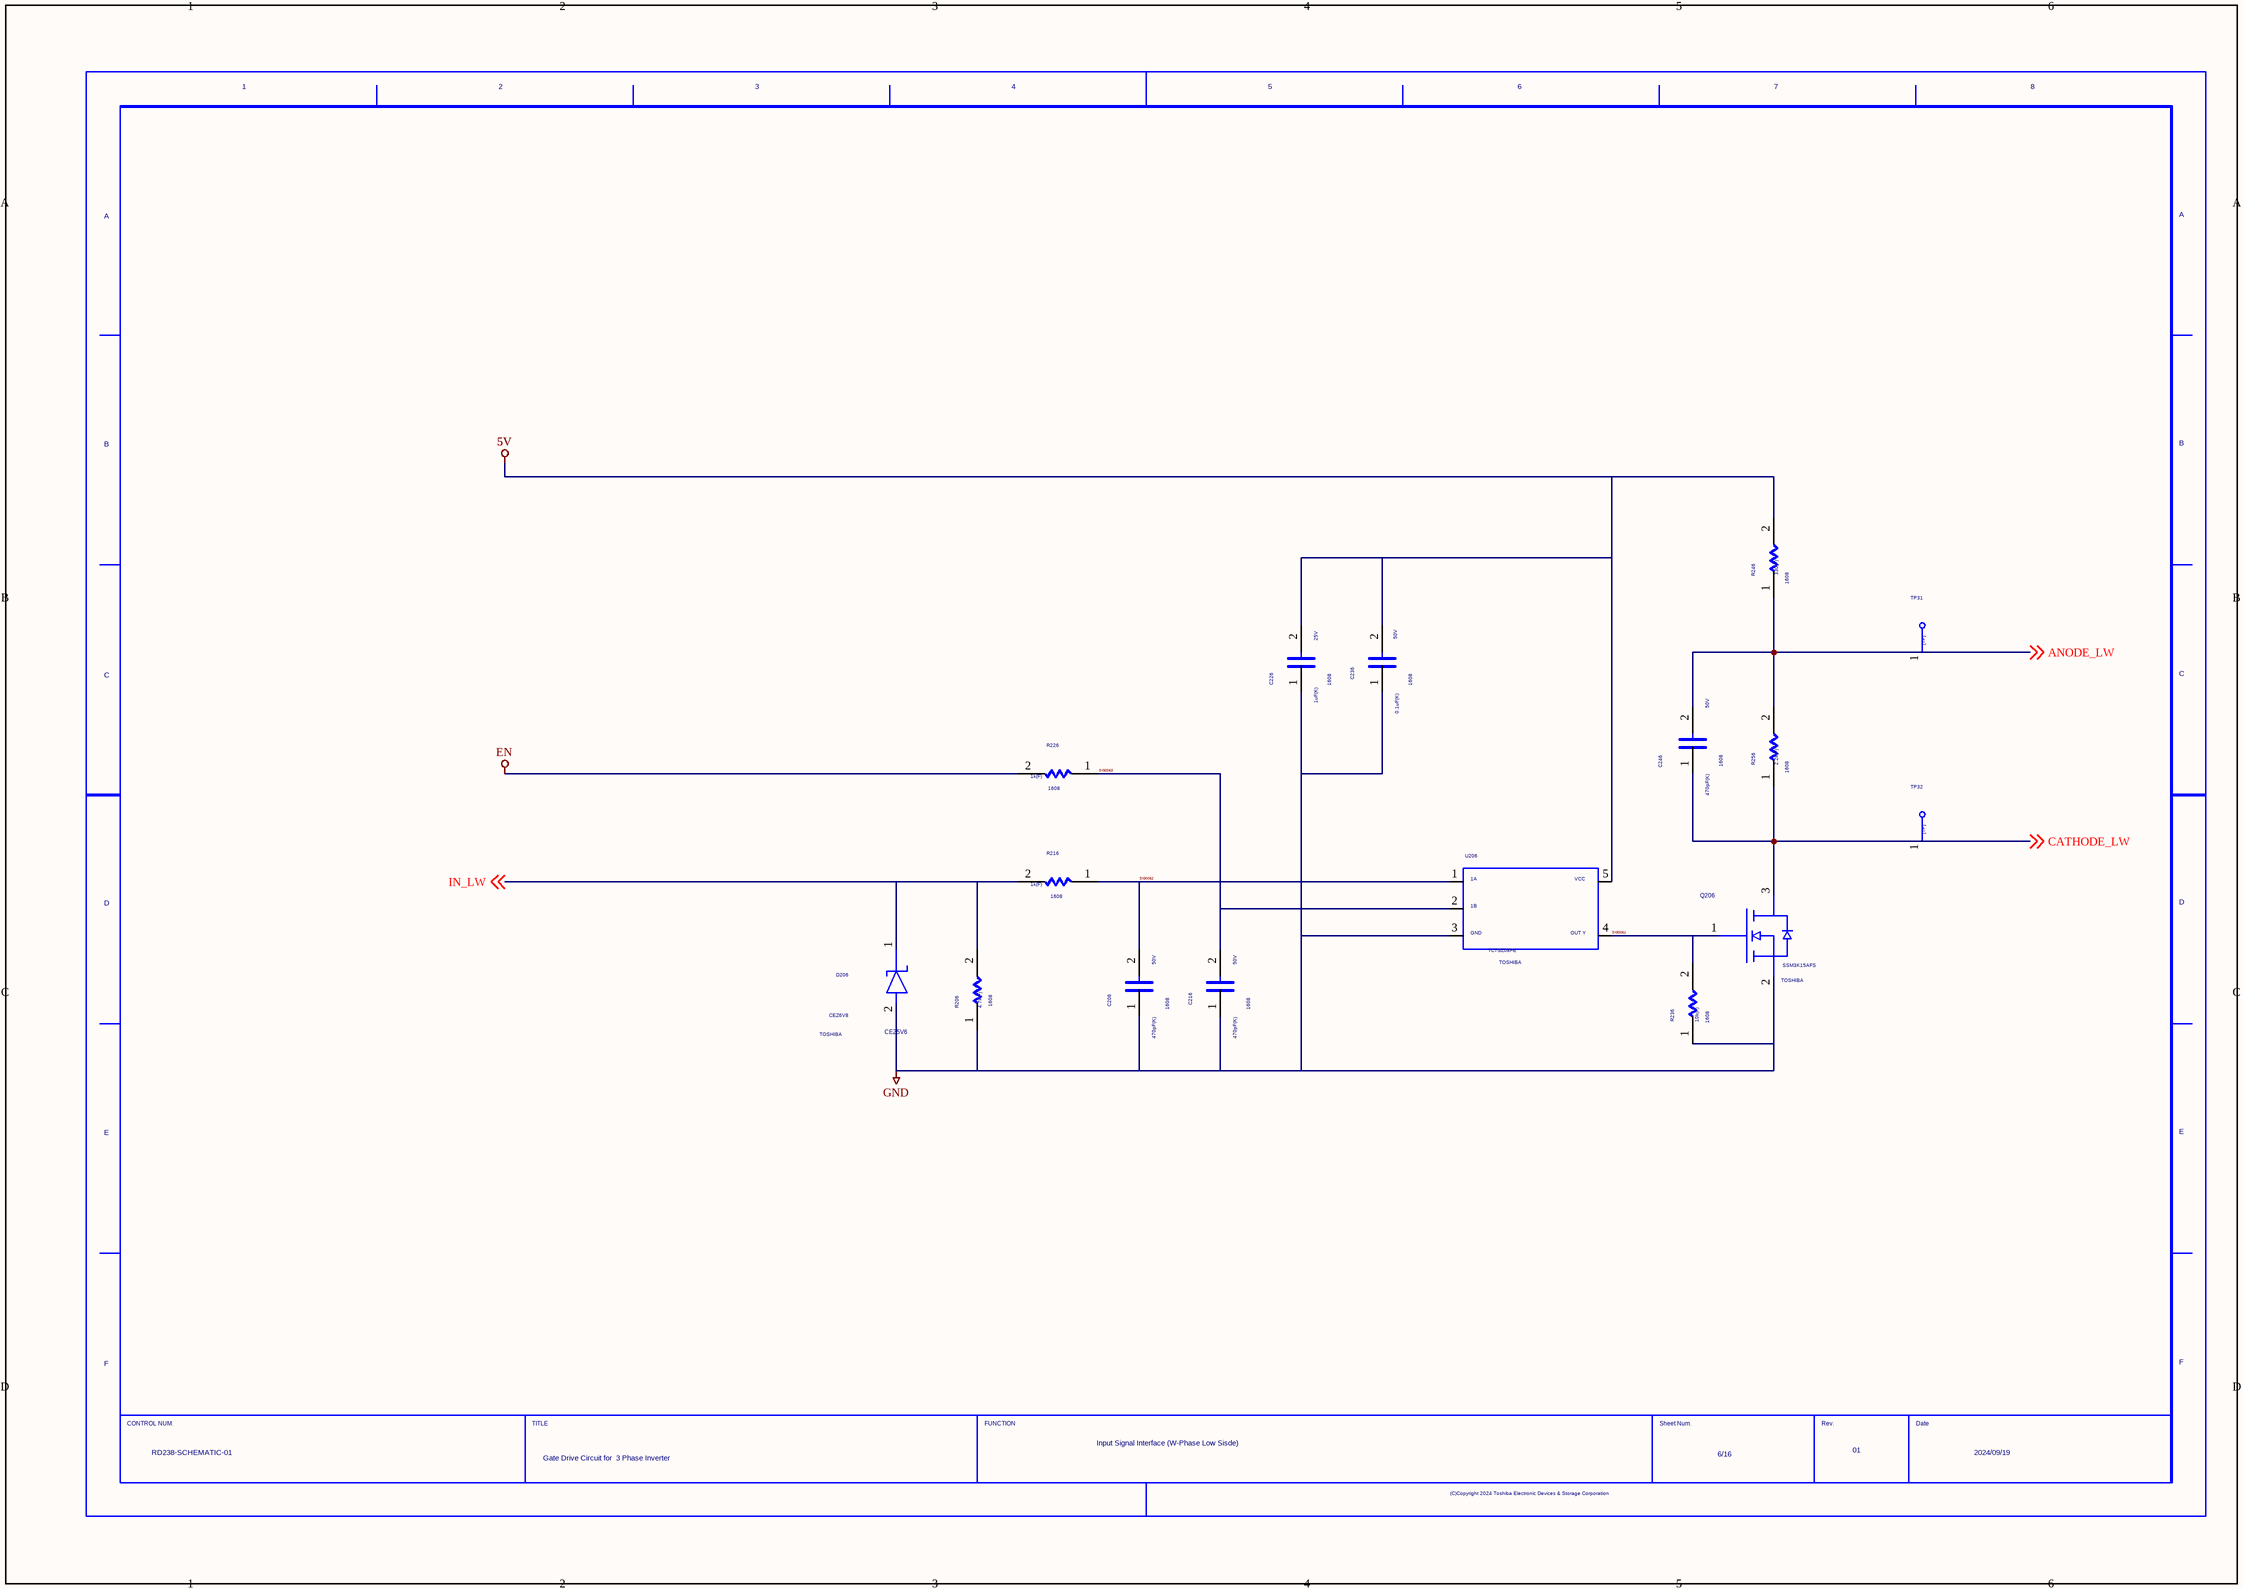
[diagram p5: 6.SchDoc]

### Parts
(Parts that share a designator on the sheet are numbered #1, #2 ... from top to bottom, then left to right.)
C206  VAL1: 470pF(K)  VAL2: 50V  SIZECODESMD: 1608  (hidden comment: C)
C216  VAL1: 470pF(K)  VAL2: 50V  SIZECODESMD: 1608  (hidden comment: C)
C226  VAL1: 1uF(K)  VAL2: 25V  SIZECODESMD: 1608  (hidden comment: C)
C236  VAL1: 0.1uF(K)  VAL2: 50V  SIZECODESMD: 1608  (hidden comment: C)
C246  VAL1: 470pF(K)  VAL2: 50V  SIZECODESMD: 1608  (hidden comment: C)
D206  CEZ5V6  USERCOMPTEXT3: TOSHIBA  VAL3: CEZ6V8
Q206  USERCOMPTEXT3: TOSHIBA  VAL3: SSM3K15AFS  (hidden comment: SSM3K318R)
R206  VAL1: 4.7k(F)  SIZECODESMD: 1608  (hidden comment: R)
R216  VAL1: 1k(F)  SIZECODESMD: 1608  (hidden comment: R)
R226  VAL1: 1k(F)  SIZECODESMD: 1608  (hidden comment: R)
R236  VAL1: 10k(F)  SIZECODESMD: 1608  (hidden comment: R)
R246  VAL1: 330(F)  SIZECODESMD: 1608  (hidden comment: R)
R256  VAL1: 2.2k(F)  SIZECODESMD: 1608  (hidden comment: R)
TP31  TP  (value not drawn)
TP32  TP  (value not drawn)
U206  USERCOMPTEXT3: TOSHIBA  (hidden comment: TCR1HF50B)
U?#6  DATE: 2024/09/19  DRAWINGNUMBER: RD238-SCHEMATIC-01  TITLE: Gate Drive Circuit for / 3 Phase Inverter  FUNCTION: Input Signal Interface / (W-Phase Low Sisde)  SHEETNUMBER: 6/16  REVISION: 01  (hidden comment: WAKU_DEF100)

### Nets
5V: C226.2 C236.2 R246.2 U206.5
EN: R226.2
GND: C206.1 C216.1 C226.1 C236.1 D206.2(ANODE) Q206.2(S) R206.1 R236.1 U206.3
ANODE_LW: C246.2 R246.1 R256.2 TP31.1 ; off-sheet ANODE_LW
CATHODE_LW: C246.1 Q206.3(D) R256.1 TP32.1 ; off-sheet CATHODE_LW
IN_LW: D206.1(CATHODE) R206.2 R216.2 ; off-sheet IN_LW
SIG0061: Q206.1(G) R236.2 U206.4
SIG0062: C206.2 R216.1 U206.1
SIG0063: C216.2 R226.1 U206.2

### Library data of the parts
C206 C216 C226 C236 C246 = C: OriginalSymbolOrigin: (2540,7620)
D206 = CEZ5V6_D500: as D202 on sheet 2
Q206 = SSM3K15AFS_Q20: as Q201 on sheet 1
R206 = R: as R201 on sheet 1
R216 R226 = R#1: as R211 on sheet 1
R236 R246 R256 = R: as R231 on sheet 1
TP31 TP32 = TP: as TP22 on sheet 2
U206 = TC7SZ08FE: as U201 on sheet 1
U?#6 = WAKU_DEF100: SAVEAREA0: 185750,-43960,448537,75779; TIME: 14:30:25; UPDATEUSER: t5459927; UPDATETIME: 10:22:17; SAVECOUNT: 9; OriginalSymbolOrigin: (10160,284480); SHTSAVECOUNT: 22

## Sheet 7.SchDoc
size 420 x 297 mm
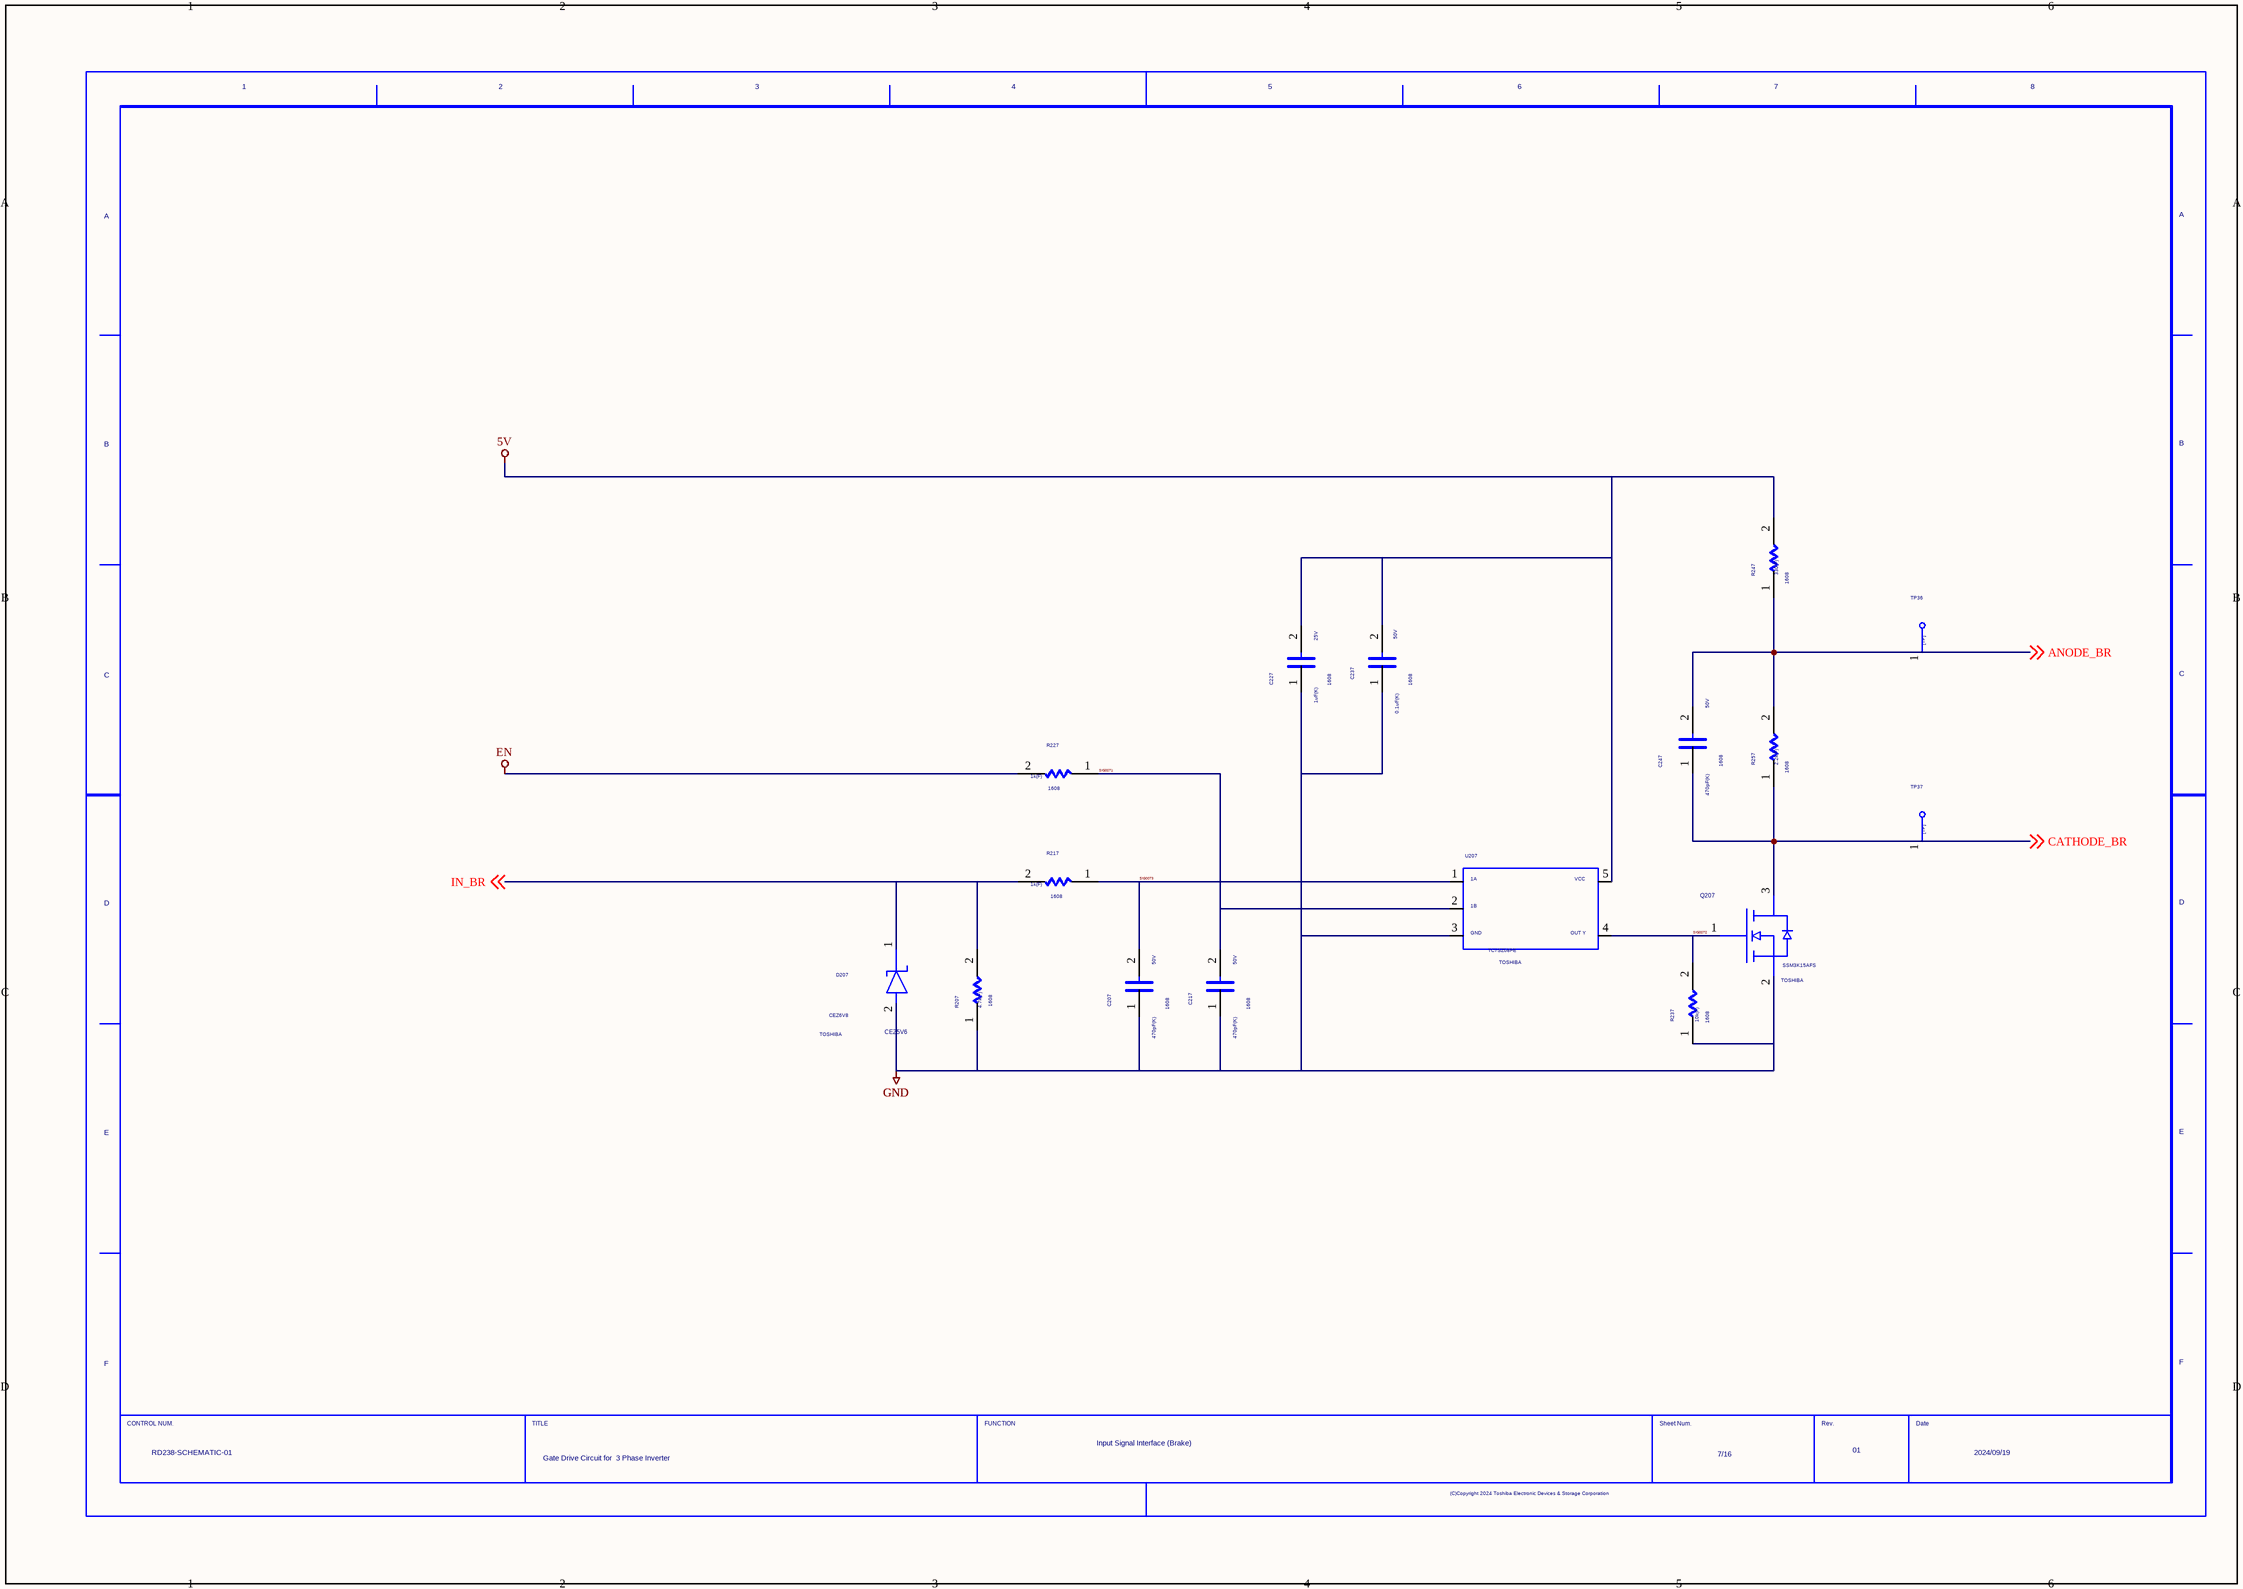
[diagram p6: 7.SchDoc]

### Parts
(Parts that share a designator on the sheet are numbered #1, #2 ... from top to bottom, then left to right.)
C207  VAL1: 470pF(K)  VAL2: 50V  SIZECODESMD: 1608  (hidden comment: C)
C217  VAL1: 470pF(K)  VAL2: 50V  SIZECODESMD: 1608  (hidden comment: C)
C227  VAL1: 1uF(K)  VAL2: 25V  SIZECODESMD: 1608  (hidden comment: C)
C237  VAL1: 0.1uF(K)  VAL2: 50V  SIZECODESMD: 1608  (hidden comment: C)
C247  VAL1: 470pF(K)  VAL2: 50V  SIZECODESMD: 1608  (hidden comment: C)
D207  CEZ5V6  USERCOMPTEXT3: TOSHIBA  VAL3: CEZ6V8
Q207  USERCOMPTEXT3: TOSHIBA  VAL3: SSM3K15AFS  (hidden comment: SSM3K318R)
R207  VAL1: 4.7k(F)  SIZECODESMD: 1608  (hidden comment: R)
R217  VAL1: 1k(F)  SIZECODESMD: 1608  (hidden comment: R)
R227  VAL1: 1k(F)  SIZECODESMD: 1608  (hidden comment: R)
R237  VAL1: 10k(F)  SIZECODESMD: 1608  (hidden comment: R)
R247  VAL1: 330(F)  SIZECODESMD: 1608  (hidden comment: R)
R257  VAL1: 2.2k(F)  SIZECODESMD: 1608  (hidden comment: R)
TP36  TP  (value not drawn)
TP37  TP  (value not drawn)
U207  USERCOMPTEXT3: TOSHIBA  (hidden comment: TCR1HF50B)
U?#7  DATE: 2024/09/19  DRAWINGNUMBER: RD238-SCHEMATIC-01  TITLE: Gate Drive Circuit for / 3 Phase Inverter  FUNCTION: Input Signal Interface / (Brake)  SHEETNUMBER: 7/16  REVISION: 01  (hidden comment: WAKU_DEF100)

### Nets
5V: C227.2 C237.2 R247.2 U207.5
EN: R227.2
GND: C207.1 C217.1 C227.1 C237.1 D207.2(ANODE) Q207.2(S) R207.1 R237.1 U207.3
ANODE_BR: C247.2 R247.1 R257.2 TP36.1 ; off-sheet ANODE_BR
CATHODE_BR: C247.1 Q207.3(D) R257.1 TP37.1 ; off-sheet CATHODE_BR
IN_BR: D207.1(CATHODE) R207.2 R217.2 ; off-sheet IN_BR
SIG0071: C217.2 R227.1 U207.2
SIG0072: Q207.1(G) R237.2 U207.4
SIG0073: C207.2 R217.1 U207.1

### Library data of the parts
C207 C217 C227 C237 C247 = C: OriginalSymbolOrigin: (2540,7620)
D207 = CEZ5V6_D500: as D202 on sheet 2
Q207 = SSM3K15AFS_Q20: as Q201 on sheet 1
R207 = R: as R201 on sheet 1
R217 R227 = R#1: as R211 on sheet 1
R237 R247 R257 = R: as R231 on sheet 1
TP36 TP37 = TP: as TP22 on sheet 2
U207 = TC7SZ08FE: as U201 on sheet 1
U?#7 = WAKU_DEF100: as U?#3 on sheet 3

## Sheet 8.SchDoc
size 420 x 297 mm
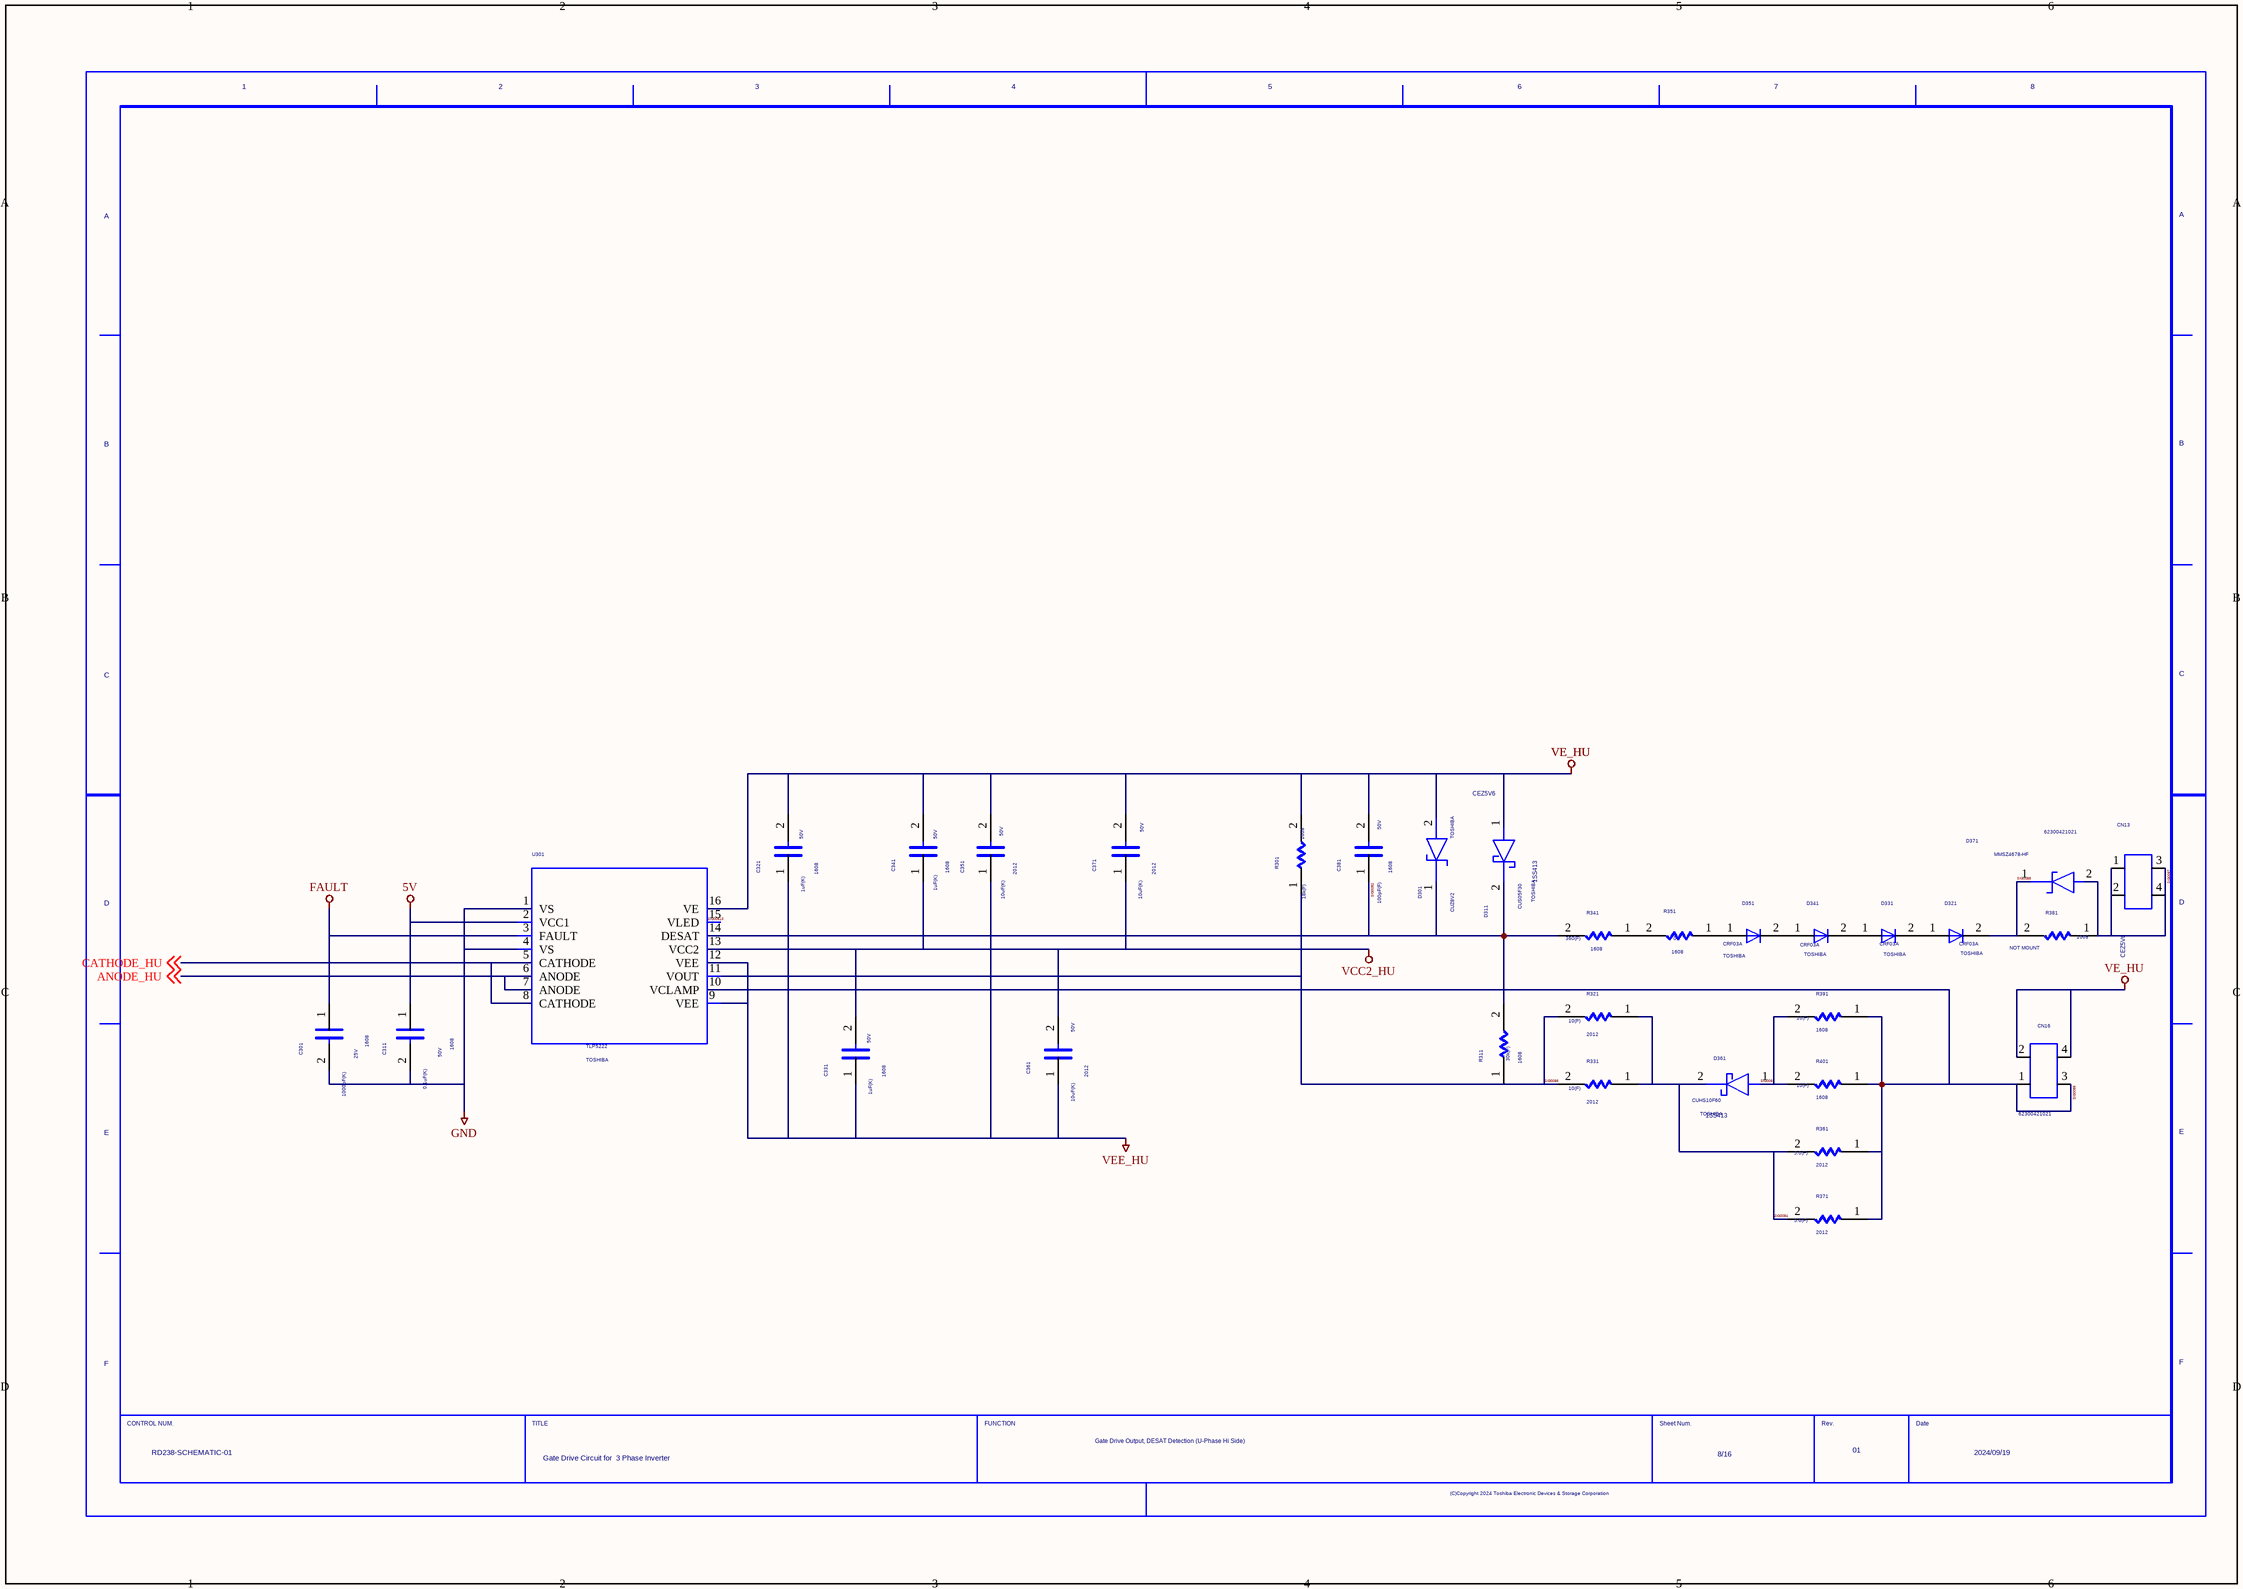
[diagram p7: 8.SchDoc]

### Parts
(Parts that share a designator on the sheet are numbered #1, #2 ... from top to bottom, then left to right.)
C301  VAL1: 1000pF(K)  VAL2: 25V  SIZECODESMD: 1608  (hidden comment: C)
C311  VAL1: 0.1uF(K)  VAL2: 50V  SIZECODESMD: 1608  (hidden comment: C)
C321  VAL1: 1uF(K)  VAL2: 50V  SIZECODESMD: 1608  (hidden comment: C)
C331  VAL1: 1uF(K)  VAL2: 50V  SIZECODESMD: 1608  (hidden comment: C)
C341  VAL1: 1uF(K)  VAL2: 50V  SIZECODESMD: 1608  (hidden comment: C)
C351  VAL1: 10uF(K)  VAL2: 50V  SIZECODESMD: 2012  (hidden comment: C)
C361  VAL1: 10uF(K)  VAL2: 50V  SIZECODESMD: 2012  (hidden comment: C)
C371  VAL1: 10uF(K)  VAL2: 50V  SIZECODESMD: 2012  (hidden comment: C)
C381  VAL1: 100pF(F)  VAL2: 50V  SIZECODESMD: 1608  (hidden comment: C)
CN13  VAL3: 62300421021  (hidden comment: TCR1HF50B)
CN16  VAL3: 62300421021  (hidden comment: TCR1HF50B)
D301  CEZ5V6  USERCOMPTEXT3: TOSHIBA  VAL3: CUZ8V2
D311  VAL3: CUS05F30  USERCOMPTEXT3: TOSHIBA  (hidden comment: 1SS413)
D321  USERCOMPTEXT3: TOSHIBA  VAL3: CRF03A  (hidden comment: D1)
D331  USERCOMPTEXT3: TOSHIBA  VAL3: CRF03A  (hidden comment: D1)
D341  USERCOMPTEXT3: TOSHIBA  VAL3: CRF03A  (hidden comment: D1)
D351  USERCOMPTEXT3: TOSHIBA  VAL3: CRF03A  (hidden comment: D1)
D361  USERCOMPTEXT3: TOSHIBA  VAL3: CUHS10F60  (hidden comment: 1SS413)
D371  CEZ5V6  VAL3: MMSZ4678-HF
R301  VAL1: 18k(F)  SIZECODESMD: 1608  (hidden comment: R)
R311  VAL1: 30k(F)  SIZECODESMD: 1608  (hidden comment: R)
R321  VAL1: 10(F)  SIZECODESMD: 2012  (hidden comment: R)
R331  VAL1: 10(F)  SIZECODESMD: 2012  (hidden comment: R)
R341  VAL1: 360(F)  SIZECODESMD: 1608  (hidden comment: R)
R351  VAL1: 0  SIZECODESMD: 1608  (hidden comment: R)
R361  VAL1: 5.6(F)  SIZECODESMD: 2012  (hidden comment: R)
R371  VAL1: 5.6(F)  SIZECODESMD: 2012  (hidden comment: R)
R381  NOTMOUNT: NOT MOUNT  VAL1: 0  SIZECODESMD: 1608  (hidden comment: R)
R391  VAL1: 10(F)  SIZECODESMD: 1608  (hidden comment: R)
R401  VAL1: 10(F)  SIZECODESMD: 1608  (hidden comment: R)
U301  USERCOMPTEXT3: TOSHIBA  (hidden comment: TLP5231)
U?#8  DATE: 2024/09/19  DRAWINGNUMBER: RD238-SCHEMATIC-01  TITLE: Gate Drive Circuit for / 3 Phase Inverter  FUNCTION: Gate Drive Output, DESAT Detection / (U-Phase Hi Side)  SHEETNUMBER: 8/16  REVISION: 01  (hidden comment: WAKU_DEF100)

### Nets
5V: C311.1 U301.2(VCC1)
FAULT: C301.1 U301.3(FAULT)
GND: C301.2 C311.2 U301.1(VS) U301.4(VS)
VCC2_HU: C331.2 C341.1 C361.2 C371.1 U301.13(VCC2)
VE_HU: C321.2 C341.2 C351.2 C371.2 C381.2 CN16.2 CN16.4 D301.2(ANODE) D311.1(ANODE) R301.2 U301.16(VE)
VEE_HU: C321.1 C331.1 C351.1 C361.1 U301.9(VEE) U301.12(VEE)
ANODE_HU: U301.6(ANODE) U301.7(ANODE) ; off-sheet ANODE_HU
CATHODE_HU: U301.5(CATHODE) U301.8(CATHODE) ; off-sheet CATHODE_HU
SIG0082: C381.1 D301.1(CATHODE) D311.2(CATHODE) R311.2 R341.2 U301.14(DESAT)
SIG0083: D361.1(ANODE) R391.2 R401.2
SIG0084: D361.2(CATHODE) R321.1 R331.1 R361.2 R371.2
SIG0085: CN16.1 CN16.3 R361.1 R371.1 R391.1 R401.1 U301.10(VCLAMP)
SIG0086: R301.1 R311.1 R321.2 R331.2 U301.11(VOUT)
SIG0087: CN13.1 CN13.2 CN13.3 CN13.4 D371.2(ANODE) R381.1
SIG0088: D321.2 D371.1(CATHODE) R381.2
SIG00813: U301.15(VLED)
NetD321_1: D321.1 D331.2
NetD331_1: D331.1 D341.2
NetD341_1: D341.1 D351.2
NetD351_1: D351.1 R351.1
NetR341_1: R341.1 R351.2

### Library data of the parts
C301 C311 C321 C331 C341 C351 C361 C371 C381 = C: OriginalSymbolOrigin: (2540,7620)
CN13 CN16 = NTC: as CN12 on sheet 1
D301 = CEZ5V6_D500: as D10 on sheet 1
D311 D361 = 1SS413_D501: ORDER: $pOrder; 特性1: 20V; 特性2: 50mA; DESCRIPTION-A: Schottky Barrier Diode, 20V, 50mA; TIME: 08:52:39; UPDATEUSER: sptcae13; SAVECOUNT: 1; OriginalSymbolOrigin: (2540,0)
D321 D331 D341 D351 = D1: SAVEAREA0: -225,-91,12804,7836; SAVECOUNT: 4; TIME: 14:49:55; UPDATEUSER: w20165dm; UPDATETIME: 14:35:38; OriginalSymbolOrigin: (5080,5080)
D371 = CEZ5V6_D500: MANUFACTURER: toshiba; ORDER: $pOrder; 特性1: 5.6V; 特性2: 5mA; DESCRIPTION-A: DIODE Zener, 5.6V, 5mA, 150mW; TIME: 08:52:39; UPDATEUSER: sptcae13; SAVECOUNT: 1; OriginalSymbolOrigin: (0,-2540)
R301 R311 = R: VAL2: 0.1W; OriginalSymbolOrigin: (5080,5080)
R321 R331 R361 R371 R391 R401 = R: VAL2: 0.5W; OriginalSymbolOrigin: (5080,5080)
R341 = R: VAL2: 0.125W; OriginalSymbolOrigin: (5080,5080)
R351 R381 = R: as R10 on sheet 1
U301 = TLP5222: ORDER: $pOrder; 特性1: 7 V,35 V; 特性2: 2.5A; DESCRIPTION-A: Gate Driver; TIME: 08:52:32; UPDATEUSER: sptcae09; UPDATETIME: 15:58:41; SAVECOUNT: 8; OriginalSymbolOrigin: (0,-22860)
U?#8 = WAKU_DEF100: SAVEAREA0: 185750,-43960,448537,75779; TIME: 14:30:25; UPDATEUSER: t5459927; UPDATETIME: 13:49:47; SAVECOUNT: 9; OriginalSymbolOrigin: (10160,284480); SHTSAVECOUNT: 29

## Sheet 9.SchDoc
size 420 x 297 mm
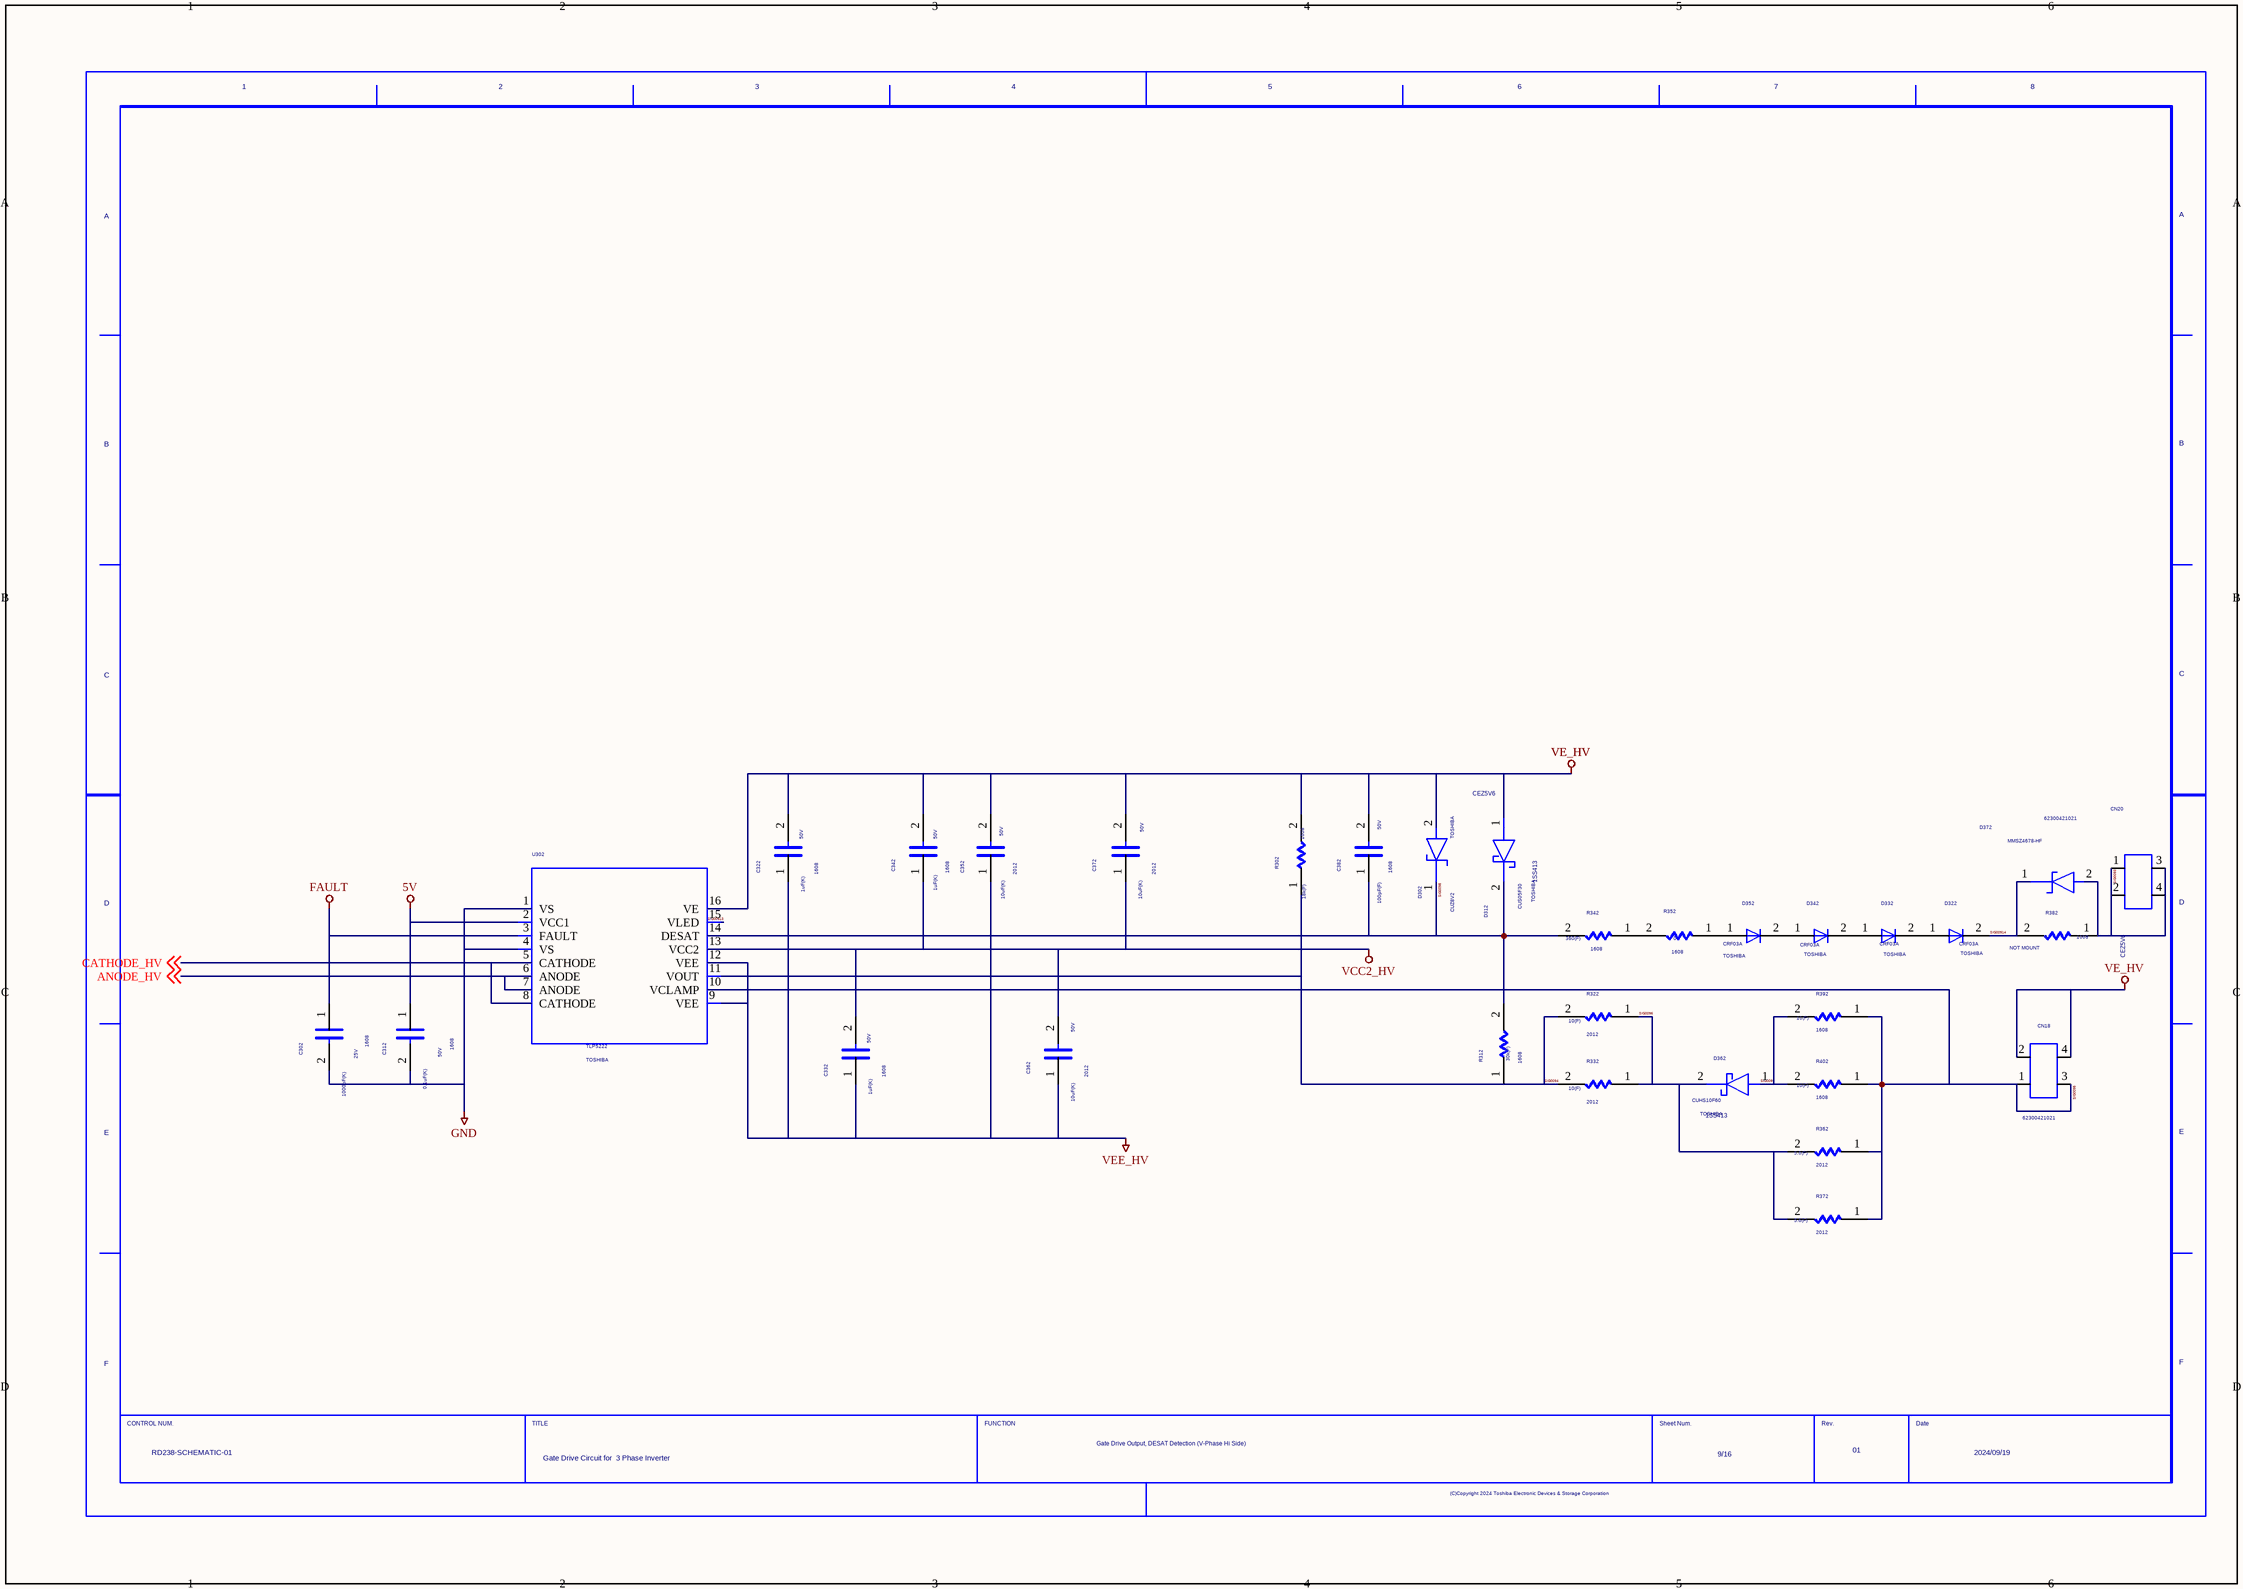
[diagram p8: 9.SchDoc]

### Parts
(Parts that share a designator on the sheet are numbered #1, #2 ... from top to bottom, then left to right.)
C302  VAL1: 1000pF(K)  VAL2: 25V  SIZECODESMD: 1608  (hidden comment: C)
C312  VAL1: 0.1uF(K)  VAL2: 50V  SIZECODESMD: 1608  (hidden comment: C)
C322  VAL1: 1uF(K)  VAL2: 50V  SIZECODESMD: 1608  (hidden comment: C)
C332  VAL1: 1uF(K)  VAL2: 50V  SIZECODESMD: 1608  (hidden comment: C)
C342  VAL1: 1uF(K)  VAL2: 50V  SIZECODESMD: 1608  (hidden comment: C)
C352  VAL1: 10uF(K)  VAL2: 50V  SIZECODESMD: 2012  (hidden comment: C)
C362  VAL1: 10uF(K)  VAL2: 50V  SIZECODESMD: 2012  (hidden comment: C)
C372  VAL1: 10uF(K)  VAL2: 50V  SIZECODESMD: 2012  (hidden comment: C)
C382  VAL1: 100pF(F)  VAL2: 50V  SIZECODESMD: 1608  (hidden comment: C)
CN18  VAL3: 62300421021  (hidden comment: TCR1HF50B)
CN20  VAL3: 62300421021  (hidden comment: TCR1HF50B)
D302  CEZ5V6  USERCOMPTEXT3: TOSHIBA  VAL3: CUZ8V2
D312  VAL3: CUS05F30  USERCOMPTEXT3: TOSHIBA  (hidden comment: 1SS413)
D322  USERCOMPTEXT3: TOSHIBA  VAL3: CRF03A  (hidden comment: D1)
D332  USERCOMPTEXT3: TOSHIBA  VAL3: CRF03A  (hidden comment: D1)
D342  USERCOMPTEXT3: TOSHIBA  VAL3: CRF03A  (hidden comment: D1)
D352  USERCOMPTEXT3: TOSHIBA  VAL3: CRF03A  (hidden comment: D1)
D362  USERCOMPTEXT3: TOSHIBA  VAL3: CUHS10F60  (hidden comment: 1SS413)
D372  CEZ5V6  VAL3: MMSZ4678-HF
R302  VAL1: 18k(F)  SIZECODESMD: 1608  (hidden comment: R)
R312  VAL1: 30k(F)  SIZECODESMD: 1608  (hidden comment: R)
R322  VAL1: 10(F)  SIZECODESMD: 2012  (hidden comment: R)
R332  VAL1: 10(F)  SIZECODESMD: 2012  (hidden comment: R)
R342  VAL1: 360(F)  SIZECODESMD: 1608  (hidden comment: R)
R352  VAL1: 0  SIZECODESMD: 1608  (hidden comment: R)
R362  VAL1: 5.6(F)  SIZECODESMD: 2012  (hidden comment: R)
R372  VAL1: 5.6(F)  SIZECODESMD: 2012  (hidden comment: R)
R382  NOTMOUNT: NOT MOUNT  VAL1: 0  SIZECODESMD: 1608  (hidden comment: R)
R392  VAL1: 10(F)  SIZECODESMD: 1608  (hidden comment: R)
R402  VAL1: 10(F)  SIZECODESMD: 1608  (hidden comment: R)
U302  USERCOMPTEXT3: TOSHIBA  (hidden comment: TLP5231)
U?#9  DATE: 2024/09/19  DRAWINGNUMBER: RD238-SCHEMATIC-01  TITLE: Gate Drive Circuit for / 3 Phase Inverter  FUNCTION: Gate Drive Output, DESAT Detection / (V-Phase Hi Side)  SHEETNUMBER: 9/16  REVISION: 01  (hidden comment: WAKU_DEF100)

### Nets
5V: C312.1 U302.2(VCC1)
FAULT: C302.1 U302.3(FAULT)
GND: C302.2 C312.2 U302.1(VS) U302.4(VS)
VCC2_HV: C332.2 C342.1 C362.2 C372.1 U302.13(VCC2)
VE_HV: C322.2 C342.2 C352.2 C372.2 C382.2 CN18.2 CN18.4 D302.2(ANODE) D312.1(ANODE) R302.2 U302.16(VE)
VEE_HV: C322.1 C332.1 C352.1 C362.1 U302.9(VEE) U302.12(VEE)
ANODE_HV: U302.6(ANODE) U302.7(ANODE) ; off-sheet ANODE_HV
CATHODE_HV: U302.5(CATHODE) U302.8(CATHODE) ; off-sheet CATHODE_HV
SIG0093: CN20.1 CN20.2 CN20.3 CN20.4 D372.2(ANODE) R382.1
SIG0094: R302.1 R312.1 R322.2 R332.2 U302.11(VOUT)
SIG0095: CN18.1 CN18.3 R362.1 R372.1 R392.1 R402.1 U302.10(VCLAMP)
SIG0096: D362.2(CATHODE) R322.1 R332.1 R362.2 R372.2
SIG0098: C382.1 D302.1(CATHODE) D312.2(CATHODE) R312.2 R342.2 U302.14(DESAT)
SIG0099: D362.1(ANODE) R392.2 R402.2
SIG00913: U302.15(VLED)
SIG00914: D322.2 D372.1(CATHODE) R382.2
NetD322_1: D322.1 D332.2
NetD332_1: D332.1 D342.2
NetD342_1: D342.1 D352.2
NetD352_1: D352.1 R352.1
NetR342_1: R342.1 R352.2

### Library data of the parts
C302 C312 C322 C332 C342 C352 C362 C372 C382 = C: OriginalSymbolOrigin: (2540,7620)
CN18 CN20 = NTC: as CN12 on sheet 1
D302 = CEZ5V6_D500: as D10 on sheet 1
D312 D362 = 1SS413_D501: as D311 on sheet 8
D322 D332 D342 D352 = D1: as D321 on sheet 8
D372 = CEZ5V6_D500: as D371 on sheet 8
R302 R312 = R: as R301 on sheet 8
R322 R332 R362 R372 R392 R402 = R: as R321 on sheet 8
R342 = R: as R341 on sheet 8
R352 R382 = R: as R10 on sheet 1
U302 = TLP5222: as U301 on sheet 8
U?#9 = WAKU_DEF100: SAVEAREA0: 185750,-43960,448537,75779; TIME: 14:30:25; UPDATEUSER: t5459927; UPDATETIME: 13:49:47; SAVECOUNT: 9; OriginalSymbolOrigin: (10160,284480); SHTSAVECOUNT: 33

## Sheet 10.SchDoc
size 420 x 297 mm
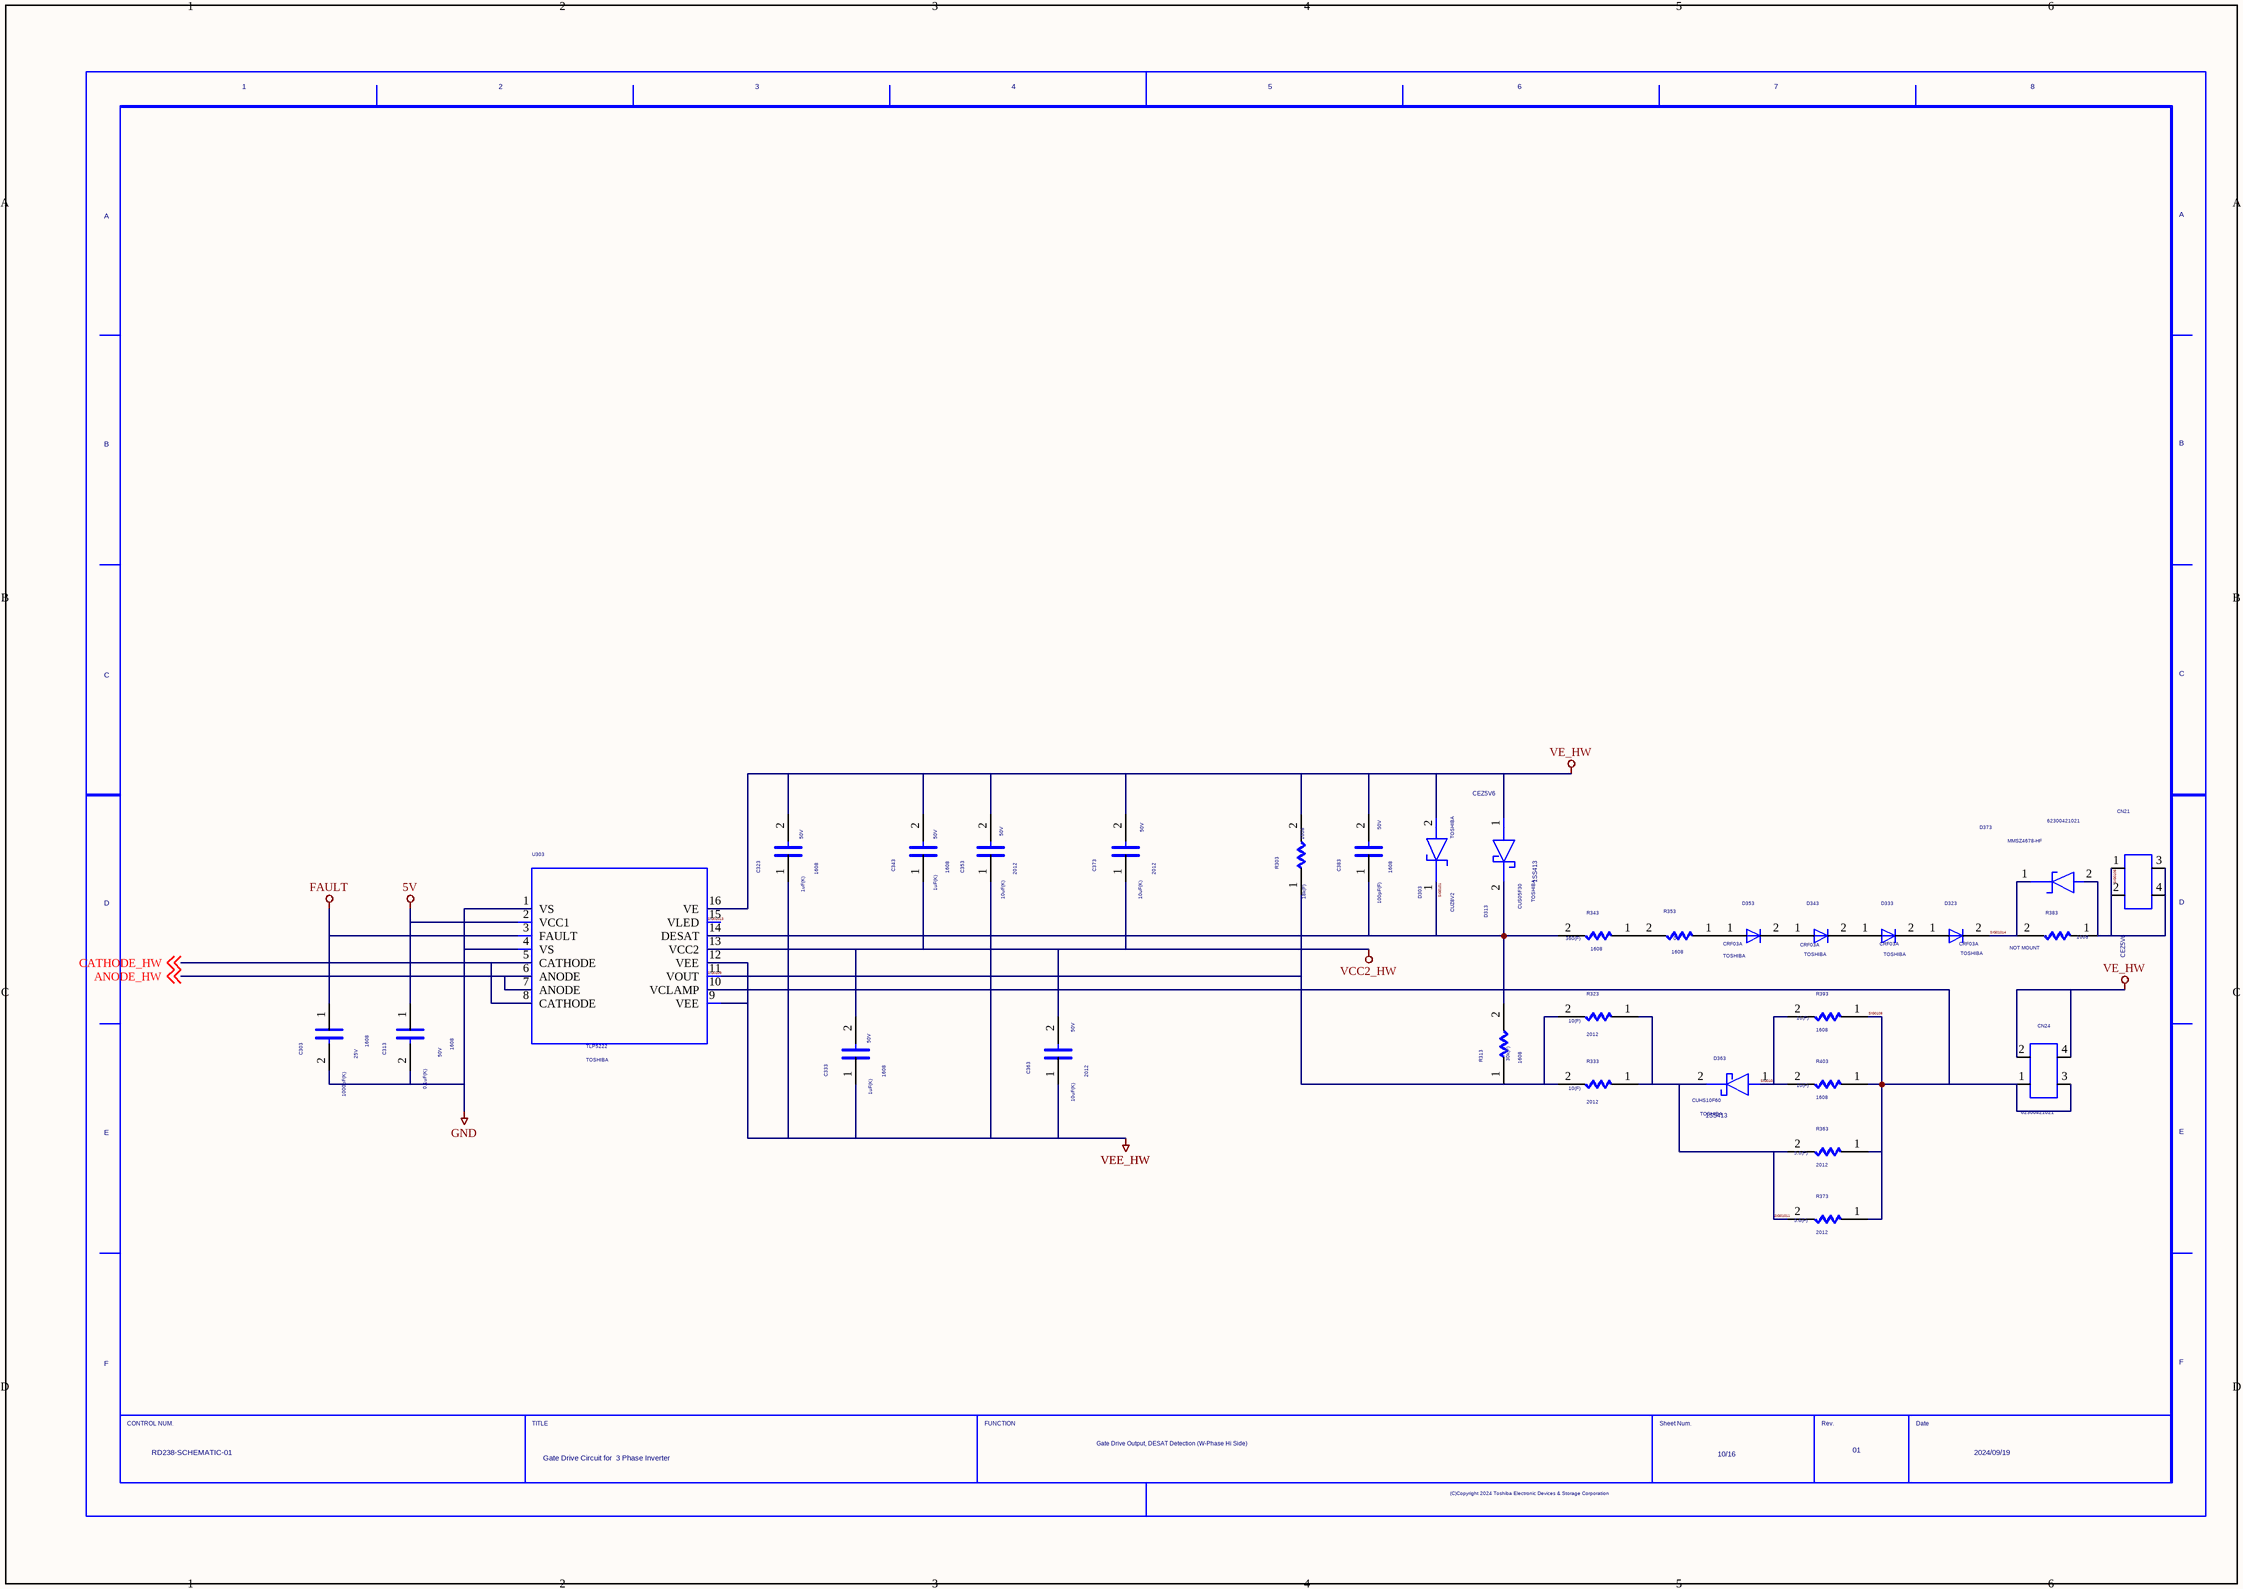
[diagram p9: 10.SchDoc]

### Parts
(Parts that share a designator on the sheet are numbered #1, #2 ... from top to bottom, then left to right.)
C303  VAL1: 1000pF(K)  VAL2: 25V  SIZECODESMD: 1608  (hidden comment: C)
C313  VAL1: 0.1uF(K)  VAL2: 50V  SIZECODESMD: 1608  (hidden comment: C)
C323  VAL1: 1uF(K)  VAL2: 50V  SIZECODESMD: 1608  (hidden comment: C)
C333  VAL1: 1uF(K)  VAL2: 50V  SIZECODESMD: 1608  (hidden comment: C)
C343  VAL1: 1uF(K)  VAL2: 50V  SIZECODESMD: 1608  (hidden comment: C)
C353  VAL1: 10uF(K)  VAL2: 50V  SIZECODESMD: 2012  (hidden comment: C)
C363  VAL1: 10uF(K)  VAL2: 50V  SIZECODESMD: 2012  (hidden comment: C)
C373  VAL1: 10uF(K)  VAL2: 50V  SIZECODESMD: 2012  (hidden comment: C)
C383  VAL1: 100pF(F)  VAL2: 50V  SIZECODESMD: 1608  (hidden comment: C)
CN21  VAL3: 62300421021  (hidden comment: TCR1HF50B)
CN24  VAL3: 62300421021  (hidden comment: TCR1HF50B)
D303  CEZ5V6  USERCOMPTEXT3: TOSHIBA  VAL3: CUZ8V2
D313  VAL3: CUS05F30  USERCOMPTEXT3: TOSHIBA  (hidden comment: 1SS413)
D323  USERCOMPTEXT3: TOSHIBA  VAL3: CRF03A  (hidden comment: D1)
D333  USERCOMPTEXT3: TOSHIBA  VAL3: CRF03A  (hidden comment: D1)
D343  USERCOMPTEXT3: TOSHIBA  VAL3: CRF03A  (hidden comment: D1)
D353  USERCOMPTEXT3: TOSHIBA  VAL3: CRF03A  (hidden comment: D1)
D363  USERCOMPTEXT3: TOSHIBA  VAL3: CUHS10F60  (hidden comment: 1SS413)
D373  CEZ5V6  VAL3: MMSZ4678-HF
R303  VAL1: 18k(F)  SIZECODESMD: 1608  (hidden comment: R)
R313  VAL1: 30k(F)  SIZECODESMD: 1608  (hidden comment: R)
R323  VAL1: 10(F)  SIZECODESMD: 2012  (hidden comment: R)
R333  VAL1: 10(F)  SIZECODESMD: 2012  (hidden comment: R)
R343  VAL1: 360(F)  SIZECODESMD: 1608  (hidden comment: R)
R353  VAL1: 0  SIZECODESMD: 1608  (hidden comment: R)
R363  VAL1: 5.6(F)  SIZECODESMD: 2012  (hidden comment: R)
R373  VAL1: 5.6(F)  SIZECODESMD: 2012  (hidden comment: R)
R383  NOTMOUNT: NOT MOUNT  VAL1: 0  SIZECODESMD: 1608  (hidden comment: R)
R393  VAL1: 10(F)  SIZECODESMD: 1608  (hidden comment: R)
R403  VAL1: 10(F)  SIZECODESMD: 1608  (hidden comment: R)
U303  USERCOMPTEXT3: TOSHIBA  (hidden comment: TLP5231)
U?#10  DATE: 2024/09/19  DRAWINGNUMBER: RD238-SCHEMATIC-01  TITLE: Gate Drive Circuit for / 3 Phase Inverter  FUNCTION: Gate Drive Output, DESAT Detection / (W-Phase Hi Side)  SHEETNUMBER: 10/16  REVISION: 01  (hidden comment: WAKU_DEF100)

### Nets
5V: C313.1 U303.2(VCC1)
FAULT: C303.1 U303.3(FAULT)
GND: C303.2 C313.2 U303.1(VS) U303.4(VS)
VCC2_HW: C333.2 C343.1 C363.2 C373.1 U303.13(VCC2)
VE_HW: C323.2 C343.2 C353.2 C373.2 C383.2 CN24.2 CN24.4 D303.2(ANODE) D313.1(ANODE) R303.2 U303.16(VE)
VEE_HW: C323.1 C333.1 C353.1 C363.1 U303.9(VEE) U303.12(VEE)
ANODE_HW: U303.6(ANODE) U303.7(ANODE) ; off-sheet ANODE_HW
CATHODE_HW: U303.5(CATHODE) U303.8(CATHODE) ; off-sheet CATHODE_HW
SIG0101: C383.1 D303.1(CATHODE) D313.2(CATHODE) R313.2 R343.2 U303.14(DESAT)
SIG0102: D363.1(ANODE) R393.2 R403.2
SIG0105: CN21.1 CN21.2 CN21.3 CN21.4 D373.2(ANODE) R383.1
SIG0108: CN24.1 CN24.3 R363.1 R373.1 R393.1 R403.1 U303.10(VCLAMP)
SIG0109: R303.1 R313.1 R323.2 R333.2 U303.11(VOUT)
SIG01011: D363.2(CATHODE) R323.1 R333.1 R363.2 R373.2
SIG01013: U303.15(VLED)
SIG01014: D323.2 D373.1(CATHODE) R383.2
NetD323_1: D323.1 D333.2
NetD333_1: D333.1 D343.2
NetD343_1: D343.1 D353.2
NetD353_1: D353.1 R353.1
NetR343_1: R343.1 R353.2

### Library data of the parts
C303 C313 C323 C333 C343 C353 C363 C373 C383 = C: OriginalSymbolOrigin: (2540,7620)
CN21 = NTC: MANUFACTURER: toshiba; ORDER: $pOrder; 特性1: 36 V; 特性2: 150mA; DESCRIPTION-A: LDO; TIME: 08:52:33; UPDATEUSER: sptcae09; UPDATETIME: 07:55:13; SAVECOUNT: 8; COMPONENTNAME: LT8306; OriginalSymbolOrigin: (5080,12700); COMP: DESAT_TOPW
CN24 = NTC: as CN12 on sheet 1
D303 = CEZ5V6_D500: as D10 on sheet 1
D313 D363 = 1SS413_D501: as D311 on sheet 8
D323 D333 D343 D353 = D1: as D321 on sheet 8
D373 = CEZ5V6_D500: as D371 on sheet 8
R303 R313 = R: as R301 on sheet 8
R323 R333 R363 R373 R393 R403 = R: as R321 on sheet 8
R343 = R: as R341 on sheet 8
R353 R383 = R: as R10 on sheet 1
U303 = TLP5222: as U301 on sheet 8
U?#10 = WAKU_DEF100: SAVEAREA0: 185750,-43960,448537,75779; TIME: 14:30:25; UPDATEUSER: t5459927; UPDATETIME: 13:49:47; SAVECOUNT: 9; OriginalSymbolOrigin: (10160,284480); COMP: VS; SHTSAVECOUNT: 30

## Sheet 11.SchDoc
size 420 x 297 mm
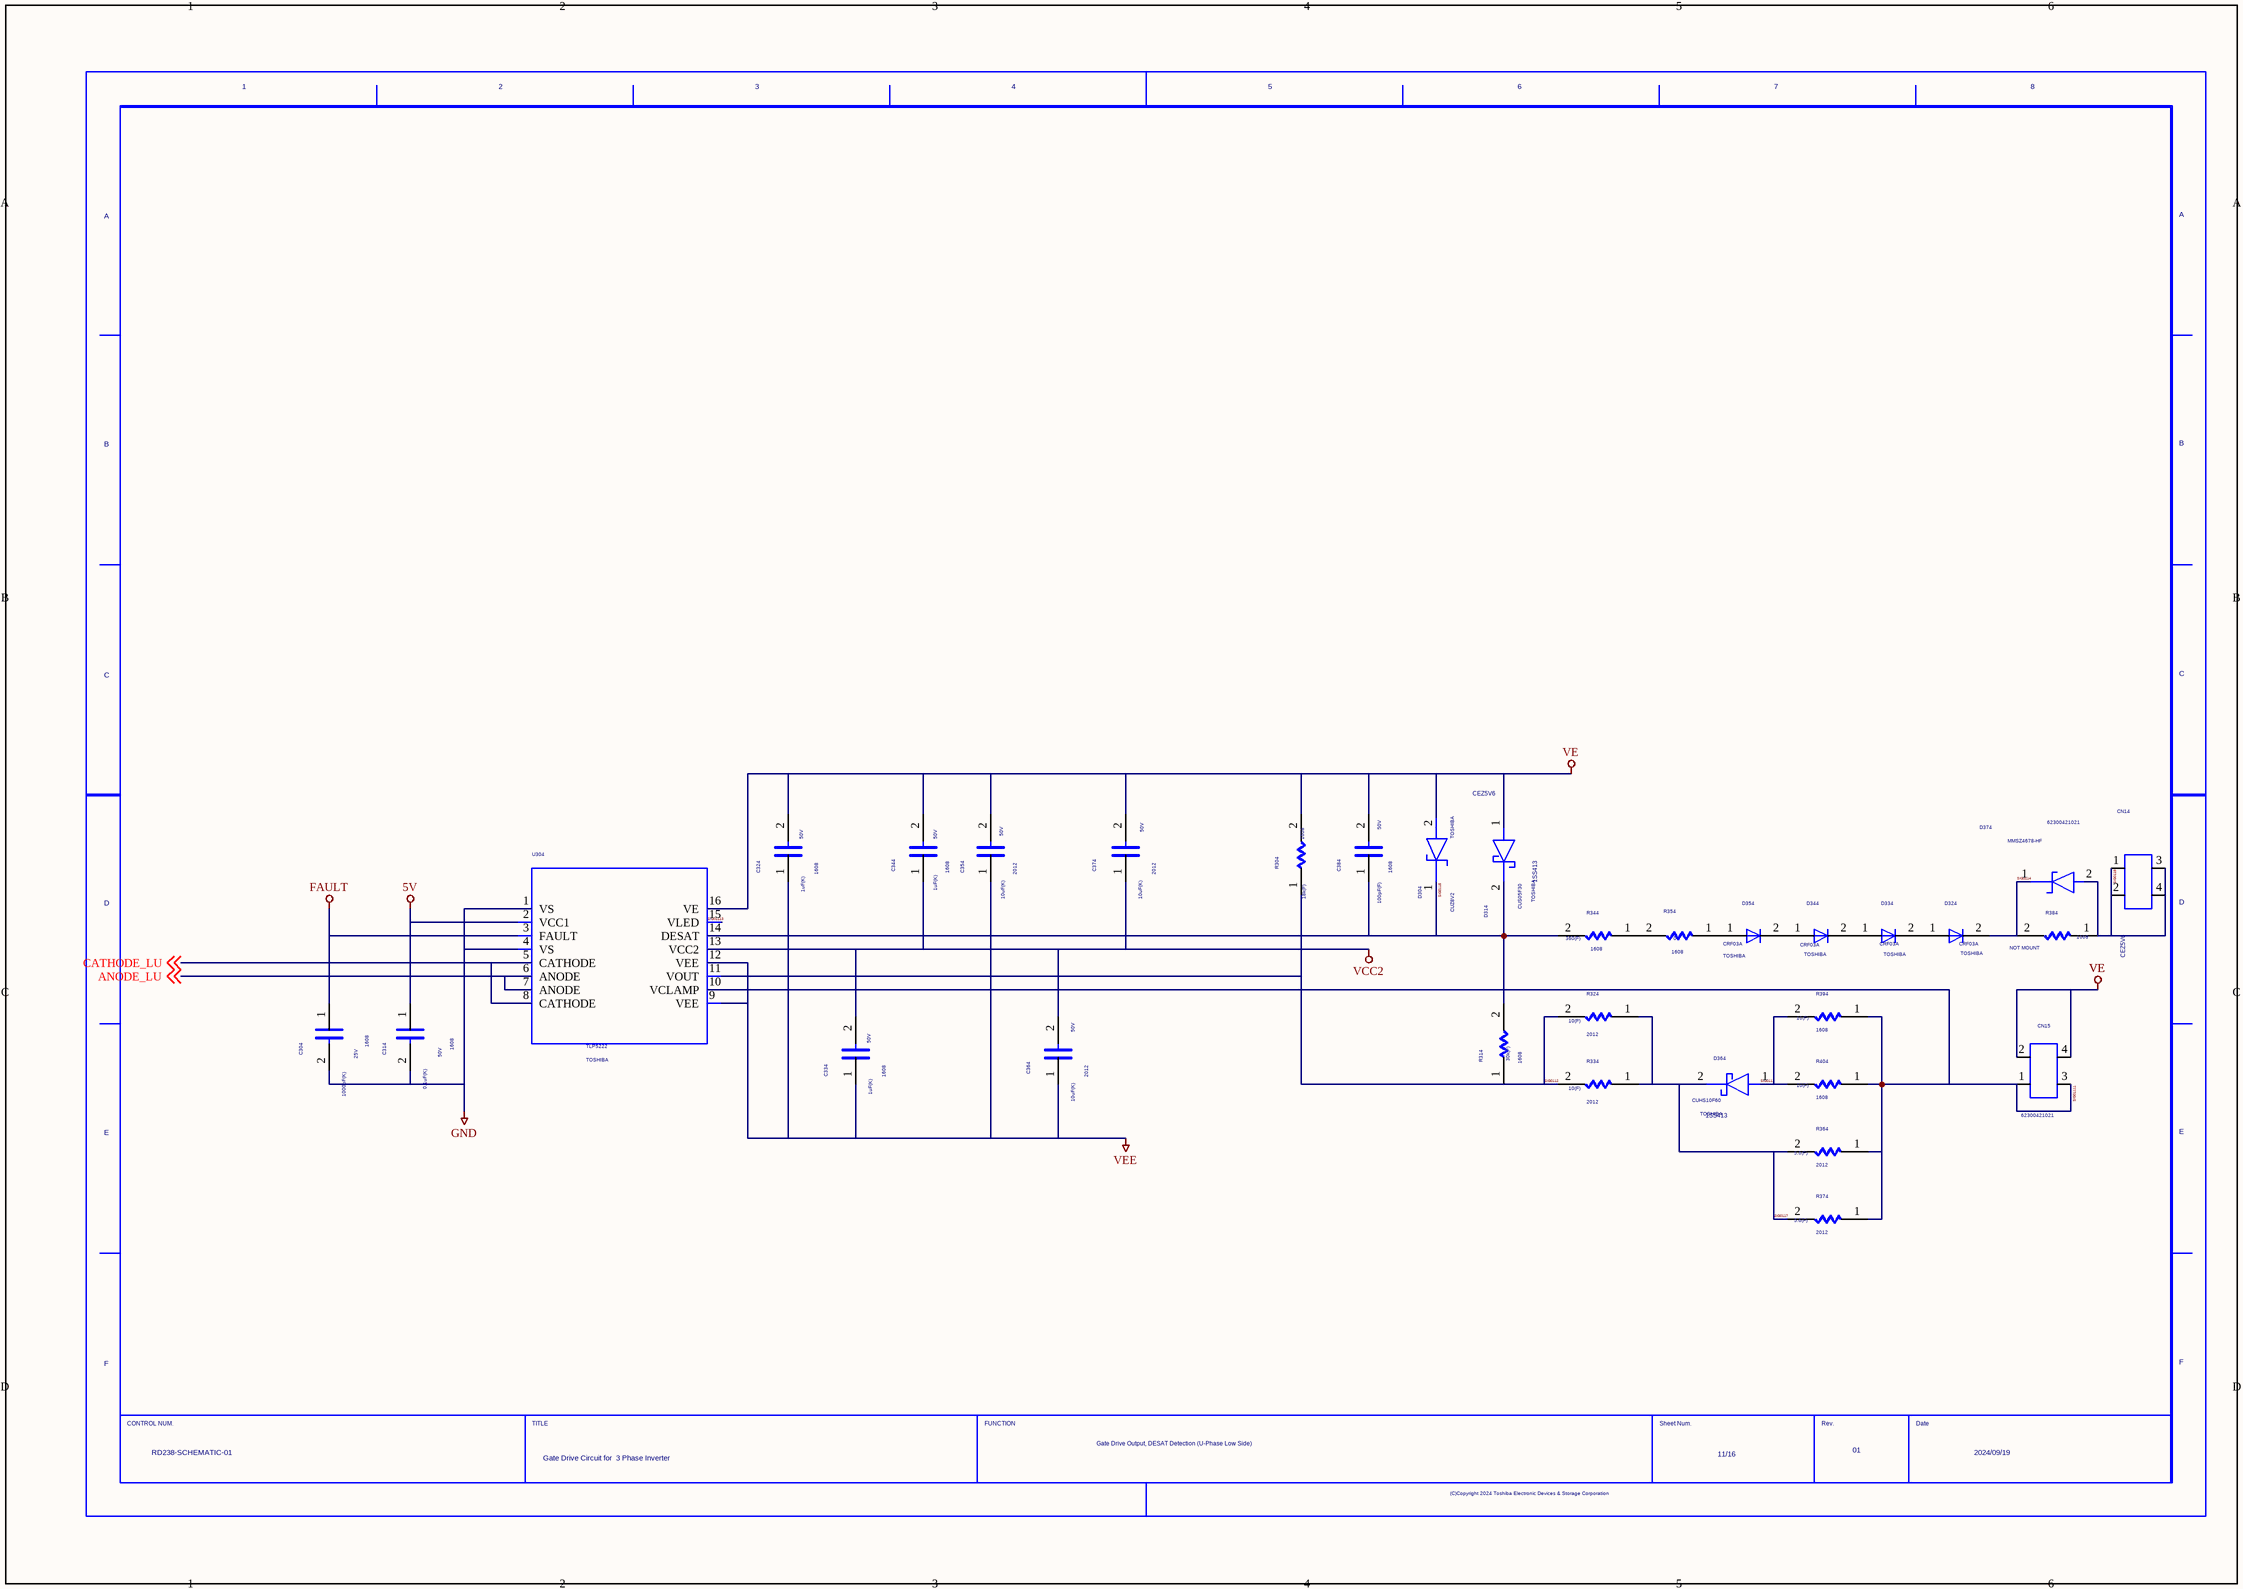
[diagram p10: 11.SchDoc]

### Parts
(Parts that share a designator on the sheet are numbered #1, #2 ... from top to bottom, then left to right.)
C304  VAL1: 1000pF(K)  VAL2: 25V  SIZECODESMD: 1608  (hidden comment: C)
C314  VAL1: 0.1uF(K)  VAL2: 50V  SIZECODESMD: 1608  (hidden comment: C)
C324  VAL1: 1uF(K)  VAL2: 50V  SIZECODESMD: 1608  (hidden comment: C)
C334  VAL1: 1uF(K)  VAL2: 50V  SIZECODESMD: 1608  (hidden comment: C)
C344  VAL1: 1uF(K)  VAL2: 50V  SIZECODESMD: 1608  (hidden comment: C)
C354  VAL1: 10uF(K)  VAL2: 50V  SIZECODESMD: 2012  (hidden comment: C)
C364  VAL1: 10uF(K)  VAL2: 50V  SIZECODESMD: 2012  (hidden comment: C)
C374  VAL1: 10uF(K)  VAL2: 50V  SIZECODESMD: 2012  (hidden comment: C)
C384  VAL1: 100pF(F)  VAL2: 50V  SIZECODESMD: 1608  (hidden comment: C)
CN14  VAL3: 62300421021  (hidden comment: TCR1HF50B)
CN15  VAL3: 62300421021  (hidden comment: TCR1HF50B)
D304  CEZ5V6  USERCOMPTEXT3: TOSHIBA  VAL3: CUZ8V2
D314  VAL3: CUS05F30  USERCOMPTEXT3: TOSHIBA  (hidden comment: 1SS413)
D324  USERCOMPTEXT3: TOSHIBA  VAL3: CRF03A  (hidden comment: D1)
D334  USERCOMPTEXT3: TOSHIBA  VAL3: CRF03A  (hidden comment: D1)
D344  USERCOMPTEXT3: TOSHIBA  VAL3: CRF03A  (hidden comment: D1)
D354  USERCOMPTEXT3: TOSHIBA  VAL3: CRF03A  (hidden comment: D1)
D364  USERCOMPTEXT3: TOSHIBA  VAL3: CUHS10F60  (hidden comment: 1SS413)
D374  CEZ5V6  VAL3: MMSZ4678-HF
R304  VAL1: 18k(F)  SIZECODESMD: 1608  (hidden comment: R)
R314  VAL1: 30k(F)  SIZECODESMD: 1608  (hidden comment: R)
R324  VAL1: 10(F)  SIZECODESMD: 2012  (hidden comment: R)
R334  VAL1: 10(F)  SIZECODESMD: 2012  (hidden comment: R)
R344  VAL1: 360(F)  SIZECODESMD: 1608  (hidden comment: R)
R354  VAL1: 0  SIZECODESMD: 1608  (hidden comment: R)
R364  VAL1: 5.6(F)  SIZECODESMD: 2012  (hidden comment: R)
R374  VAL1: 5.6(F)  SIZECODESMD: 2012  (hidden comment: R)
R384  NOTMOUNT: NOT MOUNT  VAL1: 0  SIZECODESMD: 1608  (hidden comment: R)
R394  VAL1: 10(F)  SIZECODESMD: 1608  (hidden comment: R)
R404  VAL1: 10(F)  SIZECODESMD: 1608  (hidden comment: R)
U304  USERCOMPTEXT3: TOSHIBA  (hidden comment: TLP5231)
U?#11  DATE: 2024/09/19  DRAWINGNUMBER: RD238-SCHEMATIC-01  TITLE: Gate Drive Circuit for / 3 Phase Inverter  FUNCTION: Gate Drive Output, DESAT Detection / (U-Phase Low Side)  SHEETNUMBER: 11/16  REVISION: 01  (hidden comment: WAKU_DEF100)

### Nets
5V: C314.1 U304.2(VCC1)
FAULT: C304.1 U304.3(FAULT)
GND: C304.2 C314.2 U304.1(VS) U304.4(VS)
VCC2: C334.2 C344.1 C364.2 C374.1 U304.13(VCC2)
VE: C324.2 C344.2 C354.2 C374.2 C384.2 CN15.2 CN15.4 D304.2(ANODE) D314.1(ANODE) R304.2 U304.16(VE)
VEE: C324.1 C334.1 C354.1 C364.1 U304.9(VEE) U304.12(VEE)
ANODE_LU: U304.6(ANODE) U304.7(ANODE) ; off-sheet ANODE_LU
CATHODE_LU: U304.5(CATHODE) U304.8(CATHODE) ; off-sheet CATHODE_LU
SIG0111: D364.1(ANODE) R394.2 R404.2
SIG0112: R304.1 R314.1 R324.2 R334.2 U304.11(VOUT)
SIG0114: D324.2 D374.1(CATHODE) R384.2
SIG0115: C384.1 D304.1(CATHODE) D314.2(CATHODE) R314.2 R344.2 U304.14(DESAT)
SIG0117: D364.2(CATHODE) R324.1 R334.1 R364.2 R374.2
SIG0119: CN14.1 CN14.2 CN14.3 CN14.4 D374.2(ANODE) R384.1
SIG01111: CN15.1 CN15.3 R364.1 R374.1 R394.1 R404.1 U304.10(VCLAMP)
SIG01113: U304.15(VLED)
NetD324_1: D324.1 D334.2
NetD334_1: D334.1 D344.2
NetD344_1: D344.1 D354.2
NetD354_1: D354.1 R354.1
NetR344_1: R344.1 R354.2

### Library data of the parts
C304 C314 C324 C334 C344 C354 C364 C374 C384 = C: OriginalSymbolOrigin: (2540,7620)
CN14 = NTC: MANUFACTURER: toshiba; ORDER: $pOrder; 特性1: 36 V; 特性2: 150mA; DESCRIPTION-A: LDO; TIME: 08:52:33; UPDATEUSER: sptcae09; UPDATETIME: 07:55:13; SAVECOUNT: 8; COMPONENTNAME: LT8306; OriginalSymbolOrigin: (5080,12700); COMP: DESAT_BOTU
CN15 = NTC: MANUFACTURER: toshiba; ORDER: $pOrder; 特性1: 36 V; 特性2: 150mA; DESCRIPTION-A: LDO; TIME: 08:52:33; UPDATEUSER: sptcae09; UPDATETIME: 07:55:13; SAVECOUNT: 8; COMPONENTNAME: LT8306; OriginalSymbolOrigin: (5080,12700); COMP: GS_BOTU
D304 = CEZ5V6_D500: as D10 on sheet 1
D314 D364 = 1SS413_D501: as D311 on sheet 8
D324 D334 D344 D354 = D1: as D321 on sheet 8
D374 = CEZ5V6_D500: as D371 on sheet 8
R304 R314 = R: as R301 on sheet 8
R324 R334 R364 R374 R394 R404 = R: as R321 on sheet 8
R344 = R: as R341 on sheet 8
R354 R384 = R: as R10 on sheet 1
U304 = TLP5222: as U301 on sheet 8
U?#11 = WAKU_DEF100: SAVEAREA0: 185750,-43960,448537,75779; TIME: 14:30:25; UPDATEUSER: t5459927; UPDATETIME: 13:49:47; SAVECOUNT: 9; OriginalSymbolOrigin: (10160,284480); COMP: VCC1; SHTSAVECOUNT: 34

## Sheet 12.SchDoc
size 420 x 297 mm
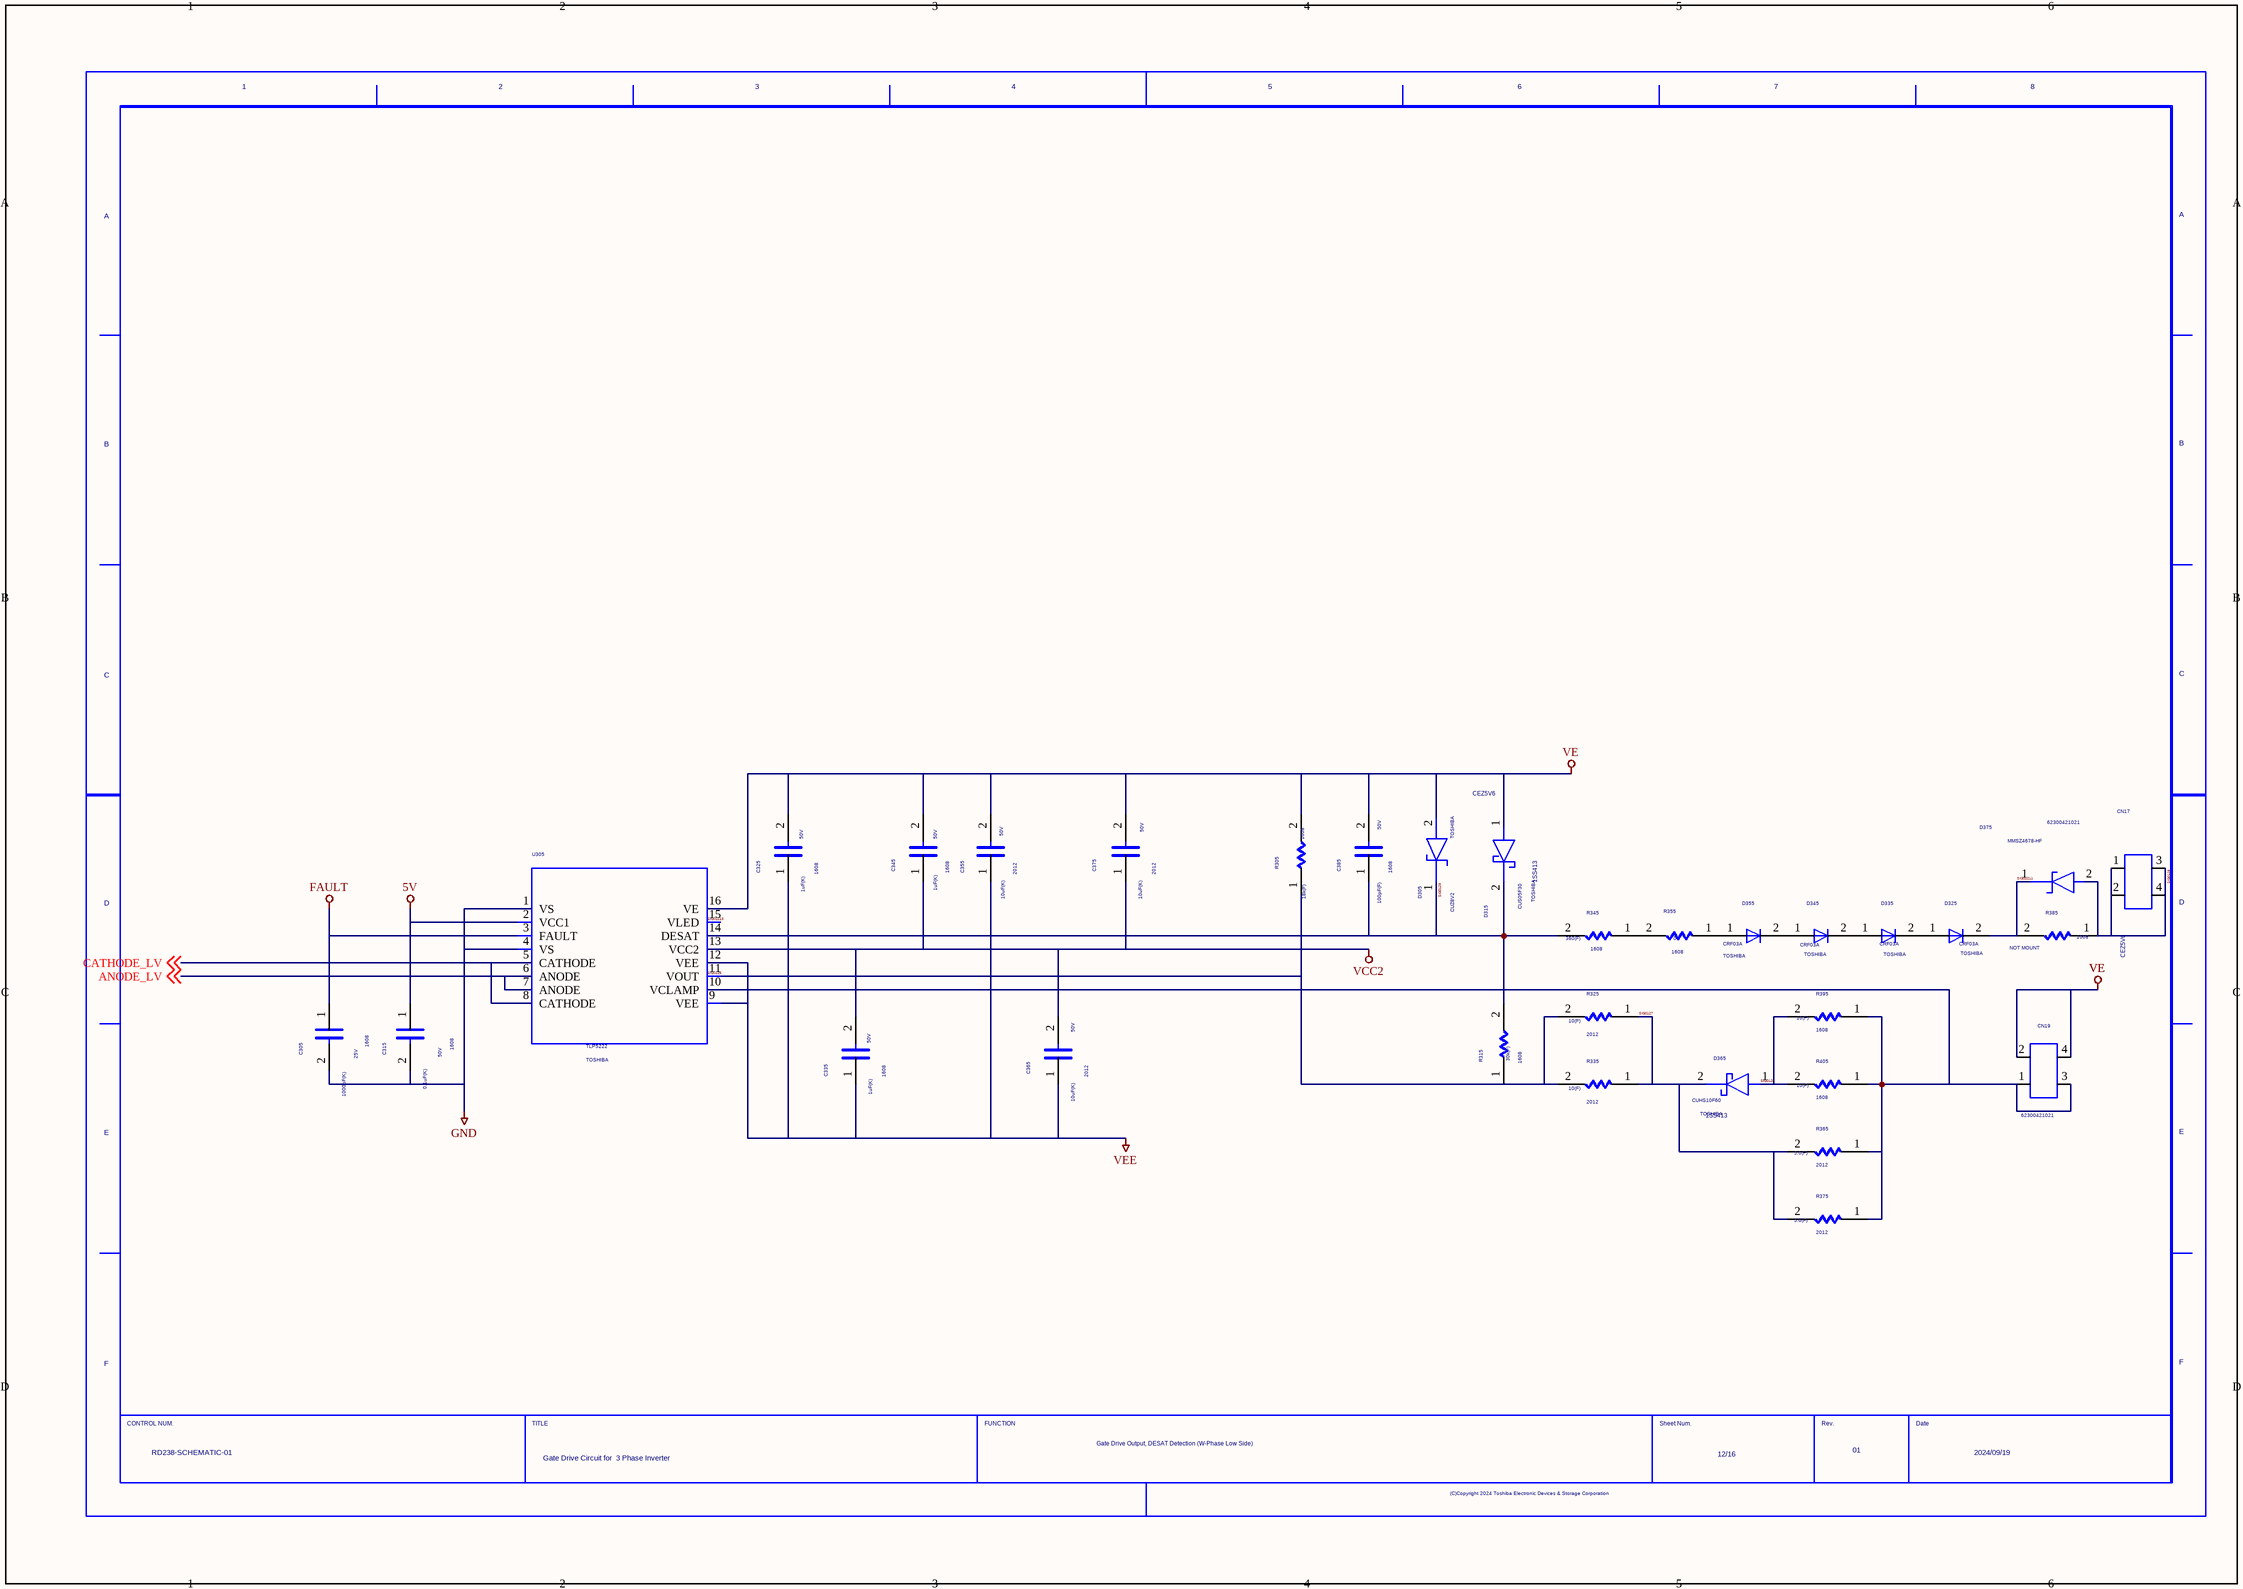
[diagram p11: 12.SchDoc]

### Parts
(Parts that share a designator on the sheet are numbered #1, #2 ... from top to bottom, then left to right.)
C305  VAL1: 1000pF(K)  VAL2: 25V  SIZECODESMD: 1608  (hidden comment: C)
C315  VAL1: 0.1uF(K)  VAL2: 50V  SIZECODESMD: 1608  (hidden comment: C)
C325  VAL1: 1uF(K)  VAL2: 50V  SIZECODESMD: 1608  (hidden comment: C)
C335  VAL1: 1uF(K)  VAL2: 50V  SIZECODESMD: 1608  (hidden comment: C)
C345  VAL1: 1uF(K)  VAL2: 50V  SIZECODESMD: 1608  (hidden comment: C)
C355  VAL1: 10uF(K)  VAL2: 50V  SIZECODESMD: 2012  (hidden comment: C)
C365  VAL1: 10uF(K)  VAL2: 50V  SIZECODESMD: 2012  (hidden comment: C)
C375  VAL1: 10uF(K)  VAL2: 50V  SIZECODESMD: 2012  (hidden comment: C)
C385  VAL1: 100pF(F)  VAL2: 50V  SIZECODESMD: 1608  (hidden comment: C)
CN17  VAL3: 62300421021  (hidden comment: TCR1HF50B)
CN19  VAL3: 62300421021  (hidden comment: TCR1HF50B)
D305  CEZ5V6  USERCOMPTEXT3: TOSHIBA  VAL3: CUZ8V2
D315  VAL3: CUS05F30  USERCOMPTEXT3: TOSHIBA  (hidden comment: 1SS413)
D325  USERCOMPTEXT3: TOSHIBA  VAL3: CRF03A  (hidden comment: D1)
D335  USERCOMPTEXT3: TOSHIBA  VAL3: CRF03A  (hidden comment: D1)
D345  USERCOMPTEXT3: TOSHIBA  VAL3: CRF03A  (hidden comment: D1)
D355  USERCOMPTEXT3: TOSHIBA  VAL3: CRF03A  (hidden comment: D1)
D365  USERCOMPTEXT3: TOSHIBA  VAL3: CUHS10F60  (hidden comment: 1SS413)
D375  CEZ5V6  VAL3: MMSZ4678-HF
R305  VAL1: 18k(F)  SIZECODESMD: 1608  (hidden comment: R)
R315  VAL1: 30k(F)  SIZECODESMD: 1608  (hidden comment: R)
R325  VAL1: 10(F)  SIZECODESMD: 2012  (hidden comment: R)
R335  VAL1: 10(F)  SIZECODESMD: 2012  (hidden comment: R)
R345  VAL1: 360(F)  SIZECODESMD: 1608  (hidden comment: R)
R355  VAL1: 0  SIZECODESMD: 1608  (hidden comment: R)
R365  VAL1: 5.6(F)  SIZECODESMD: 2012  (hidden comment: R)
R375  VAL1: 5.6(F)  SIZECODESMD: 2012  (hidden comment: R)
R385  NOTMOUNT: NOT MOUNT  VAL1: 0  SIZECODESMD: 1608  (hidden comment: R)
R395  VAL1: 10(F)  SIZECODESMD: 1608  (hidden comment: R)
R405  VAL1: 10(F)  SIZECODESMD: 1608  (hidden comment: R)
U305  USERCOMPTEXT3: TOSHIBA  (hidden comment: TLP5231)
U?#12  DATE: 2024/09/19  DRAWINGNUMBER: RD238-SCHEMATIC-01  TITLE: Gate Drive Circuit for / 3 Phase Inverter  FUNCTION: Gate Drive Output, DESAT Detection / (W-Phase Low Side)  SHEETNUMBER: 12/16  REVISION: 01  (hidden comment: WAKU_DEF100)

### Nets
5V: C315.1 U305.2(VCC1)
FAULT: C305.1 U305.3(FAULT)
GND: C305.2 C315.2 U305.1(VS) U305.4(VS)
VCC2: C335.2 C345.1 C365.2 C375.1 U305.13(VCC2)
VE: C325.2 C345.2 C355.2 C375.2 C385.2 CN19.2 CN19.4 D305.2(ANODE) D315.1(ANODE) R305.2 U305.16(VE)
VEE: C325.1 C335.1 C355.1 C365.1 U305.9(VEE) U305.12(VEE)
ANODE_LV: U305.6(ANODE) U305.7(ANODE) ; off-sheet ANODE_LV
CATHODE_LV: U305.5(CATHODE) U305.8(CATHODE) ; off-sheet CATHODE_LV
SIG0123: CN19.1 CN19.3 R365.1 R375.1 R395.1 R405.1 U305.10(VCLAMP)
SIG0125: D365.1(ANODE) R395.2 R405.2
SIG0126: R305.1 R315.1 R325.2 R335.2 U305.11(VOUT)
SIG0127: D365.2(CATHODE) R325.1 R335.1 R365.2 R375.2
SIG0128: CN17.1 CN17.2 CN17.3 CN17.4 D375.2(ANODE) R385.1
SIG0129: C385.1 D305.1(CATHODE) D315.2(CATHODE) R315.2 R345.2 U305.14(DESAT)
SIG01211: D325.2 D375.1(CATHODE) R385.2
SIG01213: U305.15(VLED)
NetD325_1: D325.1 D335.2
NetD335_1: D335.1 D345.2
NetD345_1: D345.1 D355.2
NetD355_1: D355.1 R355.1
NetR345_1: R345.1 R355.2

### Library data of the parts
C305 C315 C325 C335 C345 C355 C365 C375 C385 = C: OriginalSymbolOrigin: (2540,7620)
CN17 = NTC: MANUFACTURER: toshiba; ORDER: $pOrder; 特性1: 36 V; 特性2: 150mA; DESCRIPTION-A: LDO; TIME: 08:52:33; UPDATEUSER: sptcae09; UPDATETIME: 07:55:13; SAVECOUNT: 8; COMPONENTNAME: LT8306; OriginalSymbolOrigin: (5080,12700); COMP: DESAT_BOTV
CN19 = NTC: MANUFACTURER: toshiba; ORDER: $pOrder; 特性1: 36 V; 特性2: 150mA; DESCRIPTION-A: LDO; TIME: 08:52:33; UPDATEUSER: sptcae09; UPDATETIME: 07:55:13; SAVECOUNT: 8; COMPONENTNAME: LT8306; OriginalSymbolOrigin: (5080,12700); COMP: GS_BOTV
D305 = CEZ5V6_D500: as D10 on sheet 1
D315 D365 = 1SS413_D501: as D311 on sheet 8
D325 D335 D345 D355 = D1: as D321 on sheet 8
D375 = CEZ5V6_D500: as D371 on sheet 8
R305 R315 = R: as R301 on sheet 8
R325 R335 R365 R375 R395 R405 = R: as R321 on sheet 8
R345 = R: as R341 on sheet 8
R355 R385 = R: as R10 on sheet 1
U305 = TLP5222: as U301 on sheet 8
U?#12 = WAKU_DEF100: as U?#11 on sheet 11

## Sheet 13.SchDoc
size 420 x 297 mm
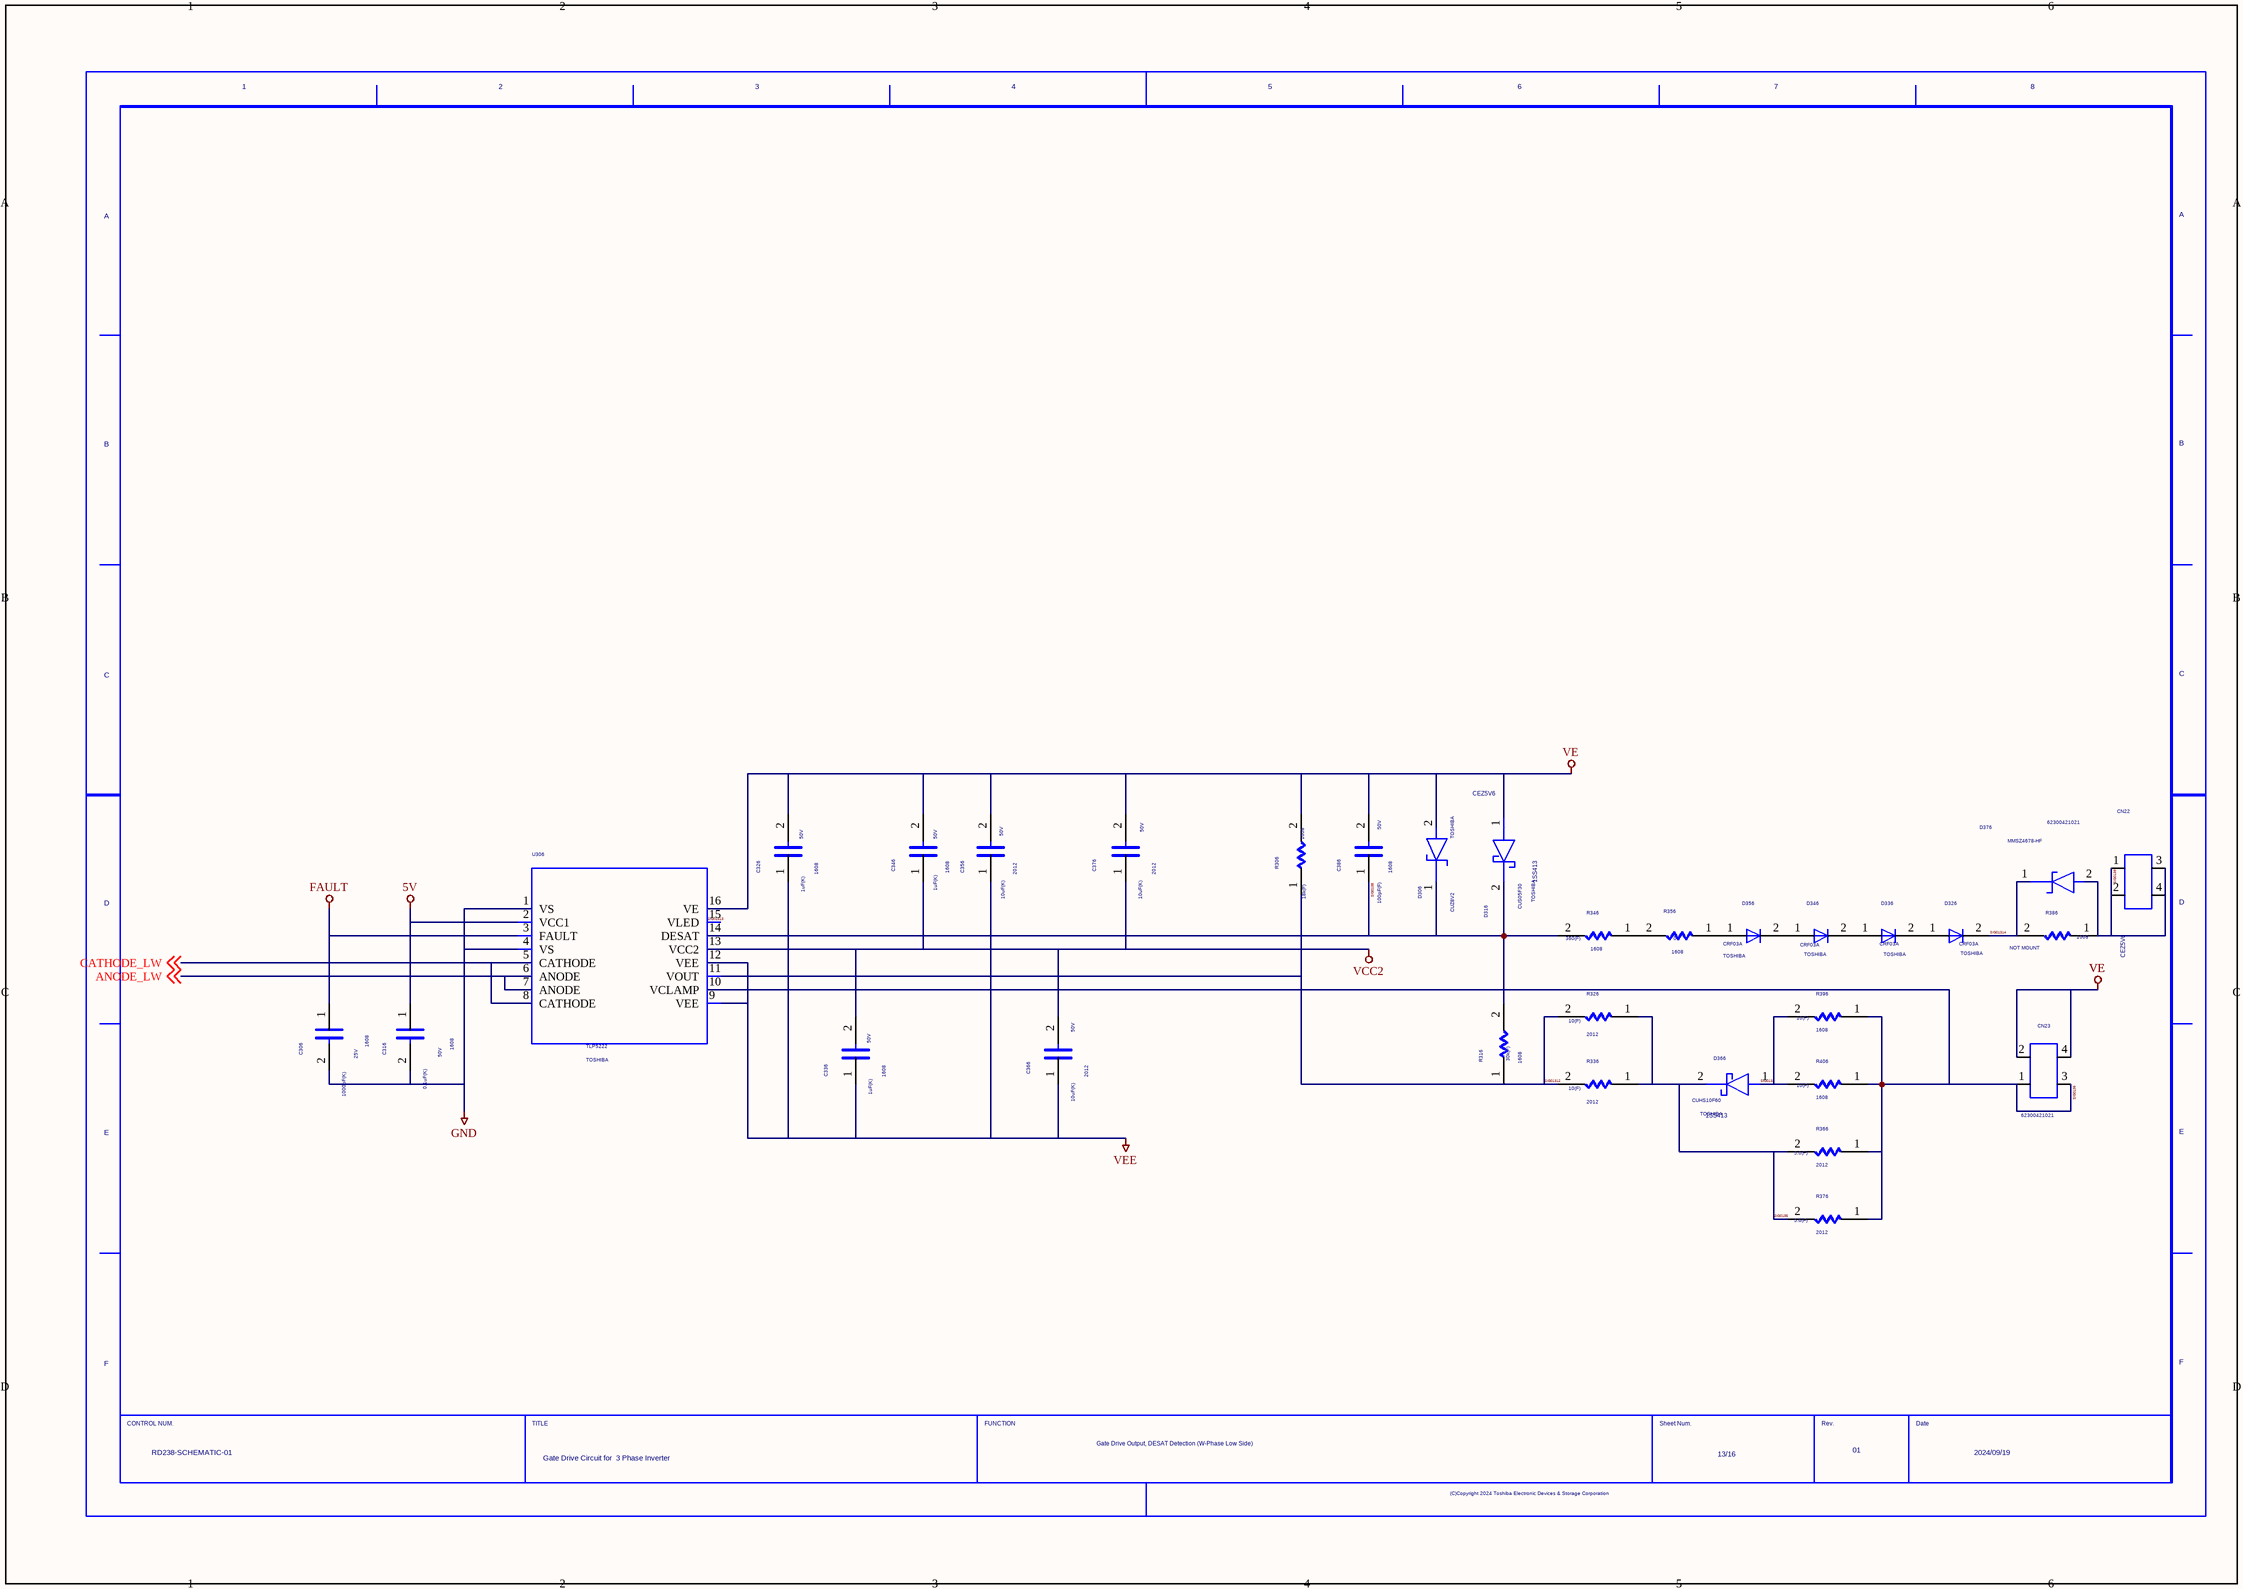
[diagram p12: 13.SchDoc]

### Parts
(Parts that share a designator on the sheet are numbered #1, #2 ... from top to bottom, then left to right.)
C306  VAL1: 1000pF(K)  VAL2: 25V  SIZECODESMD: 1608  (hidden comment: C)
C316  VAL1: 0.1uF(K)  VAL2: 50V  SIZECODESMD: 1608  (hidden comment: C)
C326  VAL1: 1uF(K)  VAL2: 50V  SIZECODESMD: 1608  (hidden comment: C)
C336  VAL1: 1uF(K)  VAL2: 50V  SIZECODESMD: 1608  (hidden comment: C)
C346  VAL1: 1uF(K)  VAL2: 50V  SIZECODESMD: 1608  (hidden comment: C)
C356  VAL1: 10uF(K)  VAL2: 50V  SIZECODESMD: 2012  (hidden comment: C)
C366  VAL1: 10uF(K)  VAL2: 50V  SIZECODESMD: 2012  (hidden comment: C)
C376  VAL1: 10uF(K)  VAL2: 50V  SIZECODESMD: 2012  (hidden comment: C)
C386  VAL1: 100pF(F)  VAL2: 50V  SIZECODESMD: 1608  (hidden comment: C)
CN22  VAL3: 62300421021  (hidden comment: TCR1HF50B)
CN23  VAL3: 62300421021  (hidden comment: TCR1HF50B)
D306  CEZ5V6  USERCOMPTEXT3: TOSHIBA  VAL3: CUZ8V2
D316  VAL3: CUS05F30  USERCOMPTEXT3: TOSHIBA  (hidden comment: 1SS413)
D326  USERCOMPTEXT3: TOSHIBA  VAL3: CRF03A  (hidden comment: D1)
D336  USERCOMPTEXT3: TOSHIBA  VAL3: CRF03A  (hidden comment: D1)
D346  USERCOMPTEXT3: TOSHIBA  VAL3: CRF03A  (hidden comment: D1)
D356  USERCOMPTEXT3: TOSHIBA  VAL3: CRF03A  (hidden comment: D1)
D366  USERCOMPTEXT3: TOSHIBA  VAL3: CUHS10F60  (hidden comment: 1SS413)
D376  CEZ5V6  VAL3: MMSZ4678-HF
R306  VAL1: 18k(F)  SIZECODESMD: 1608  (hidden comment: R)
R316  VAL1: 30k(F)  SIZECODESMD: 1608  (hidden comment: R)
R326  VAL1: 10(F)  SIZECODESMD: 2012  (hidden comment: R)
R336  VAL1: 10(F)  SIZECODESMD: 2012  (hidden comment: R)
R346  VAL1: 360(F)  SIZECODESMD: 1608  (hidden comment: R)
R356  VAL1: 0  SIZECODESMD: 1608  (hidden comment: R)
R366  VAL1: 5.6(F)  SIZECODESMD: 2012  (hidden comment: R)
R376  VAL1: 5.6(F)  SIZECODESMD: 2012  (hidden comment: R)
R386  NOTMOUNT: NOT MOUNT  VAL1: 0  SIZECODESMD: 1608  (hidden comment: R)
R396  VAL1: 10(F)  SIZECODESMD: 1608  (hidden comment: R)
R406  VAL1: 10(F)  SIZECODESMD: 1608  (hidden comment: R)
U306  USERCOMPTEXT3: TOSHIBA  (hidden comment: TLP5231)
U?#13  DATE: 2024/09/19  DRAWINGNUMBER: RD238-SCHEMATIC-01  TITLE: Gate Drive Circuit for / 3 Phase Inverter  FUNCTION: Gate Drive Output, DESAT Detection / (W-Phase Low Side)  SHEETNUMBER: 13/16  REVISION: 01  (hidden comment: WAKU_DEF100)

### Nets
5V: C316.1 U306.2(VCC1)
FAULT: C306.1 U306.3(FAULT)
GND: C306.2 C316.2 U306.1(VS) U306.4(VS)
VCC2: C336.2 C346.1 C366.2 C376.1 U306.13(VCC2)
VE: C326.2 C346.2 C356.2 C376.2 C386.2 CN23.2 CN23.4 D306.2(ANODE) D316.1(ANODE) R306.2 U306.16(VE)
VEE: C326.1 C336.1 C356.1 C366.1 U306.9(VEE) U306.12(VEE)
ANODE_LW: U306.6(ANODE) U306.7(ANODE) ; off-sheet ANODE_LW
CATHODE_LW: U306.5(CATHODE) U306.8(CATHODE) ; off-sheet CATHODE_LW
SIG0132: D366.1(ANODE) R396.2 R406.2
SIG0135: D366.2(CATHODE) R326.1 R336.1 R366.2 R376.2
SIG0136: CN23.1 CN23.3 R366.1 R376.1 R396.1 R406.1 U306.10(VCLAMP)
SIG0138: C386.1 D306.1(CATHODE) D316.2(CATHODE) R316.2 R346.2 U306.14(DESAT)
SIG0139: CN22.1 CN22.2 CN22.3 CN22.4 D376.2(ANODE) R386.1
SIG01312: R306.1 R316.1 R326.2 R336.2 U306.11(VOUT)
SIG01313: U306.15(VLED)
SIG01314: D326.2 D376.1(CATHODE) R386.2
NetD326_1: D326.1 D336.2
NetD336_1: D336.1 D346.2
NetD346_1: D346.1 D356.2
NetD356_1: D356.1 R356.1
NetR346_1: R346.1 R356.2

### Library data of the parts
C306 C316 C326 C336 C346 C356 C366 C376 C386 = C: OriginalSymbolOrigin: (2540,7620)
CN22 = NTC: MANUFACTURER: toshiba; ORDER: $pOrder; 特性1: 36 V; 特性2: 150mA; DESCRIPTION-A: LDO; TIME: 08:52:33; UPDATEUSER: sptcae09; UPDATETIME: 07:55:13; SAVECOUNT: 8; COMPONENTNAME: LT8306; OriginalSymbolOrigin: (5080,12700); COMP: DESAT_BOTW
CN23 = NTC: MANUFACTURER: toshiba; ORDER: $pOrder; 特性1: 36 V; 特性2: 150mA; DESCRIPTION-A: LDO; TIME: 08:52:33; UPDATEUSER: sptcae09; UPDATETIME: 07:55:13; SAVECOUNT: 8; COMPONENTNAME: LT8306; OriginalSymbolOrigin: (5080,12700); COMP: GS_BOTW
D306 = CEZ5V6_D500: as D10 on sheet 1
D316 D366 = 1SS413_D501: as D311 on sheet 8
D326 D336 D346 D356 = D1: as D321 on sheet 8
D376 = CEZ5V6_D500: as D371 on sheet 8
R306 R316 = R: as R301 on sheet 8
R326 R336 R366 R376 R396 R406 = R: as R321 on sheet 8
R346 = R: as R341 on sheet 8
R356 R386 = R: as R10 on sheet 1
U306 = TLP5222: as U301 on sheet 8
U?#13 = WAKU_DEF100: SAVEAREA0: 185750,-43960,448537,75779; TIME: 14:30:25; UPDATEUSER: t5459927; UPDATETIME: 13:49:47; SAVECOUNT: 9; OriginalSymbolOrigin: (10160,284480); COMP: VCC1; SHTSAVECOUNT: 29

## Sheet 14.SchDoc
size 420 x 297 mm
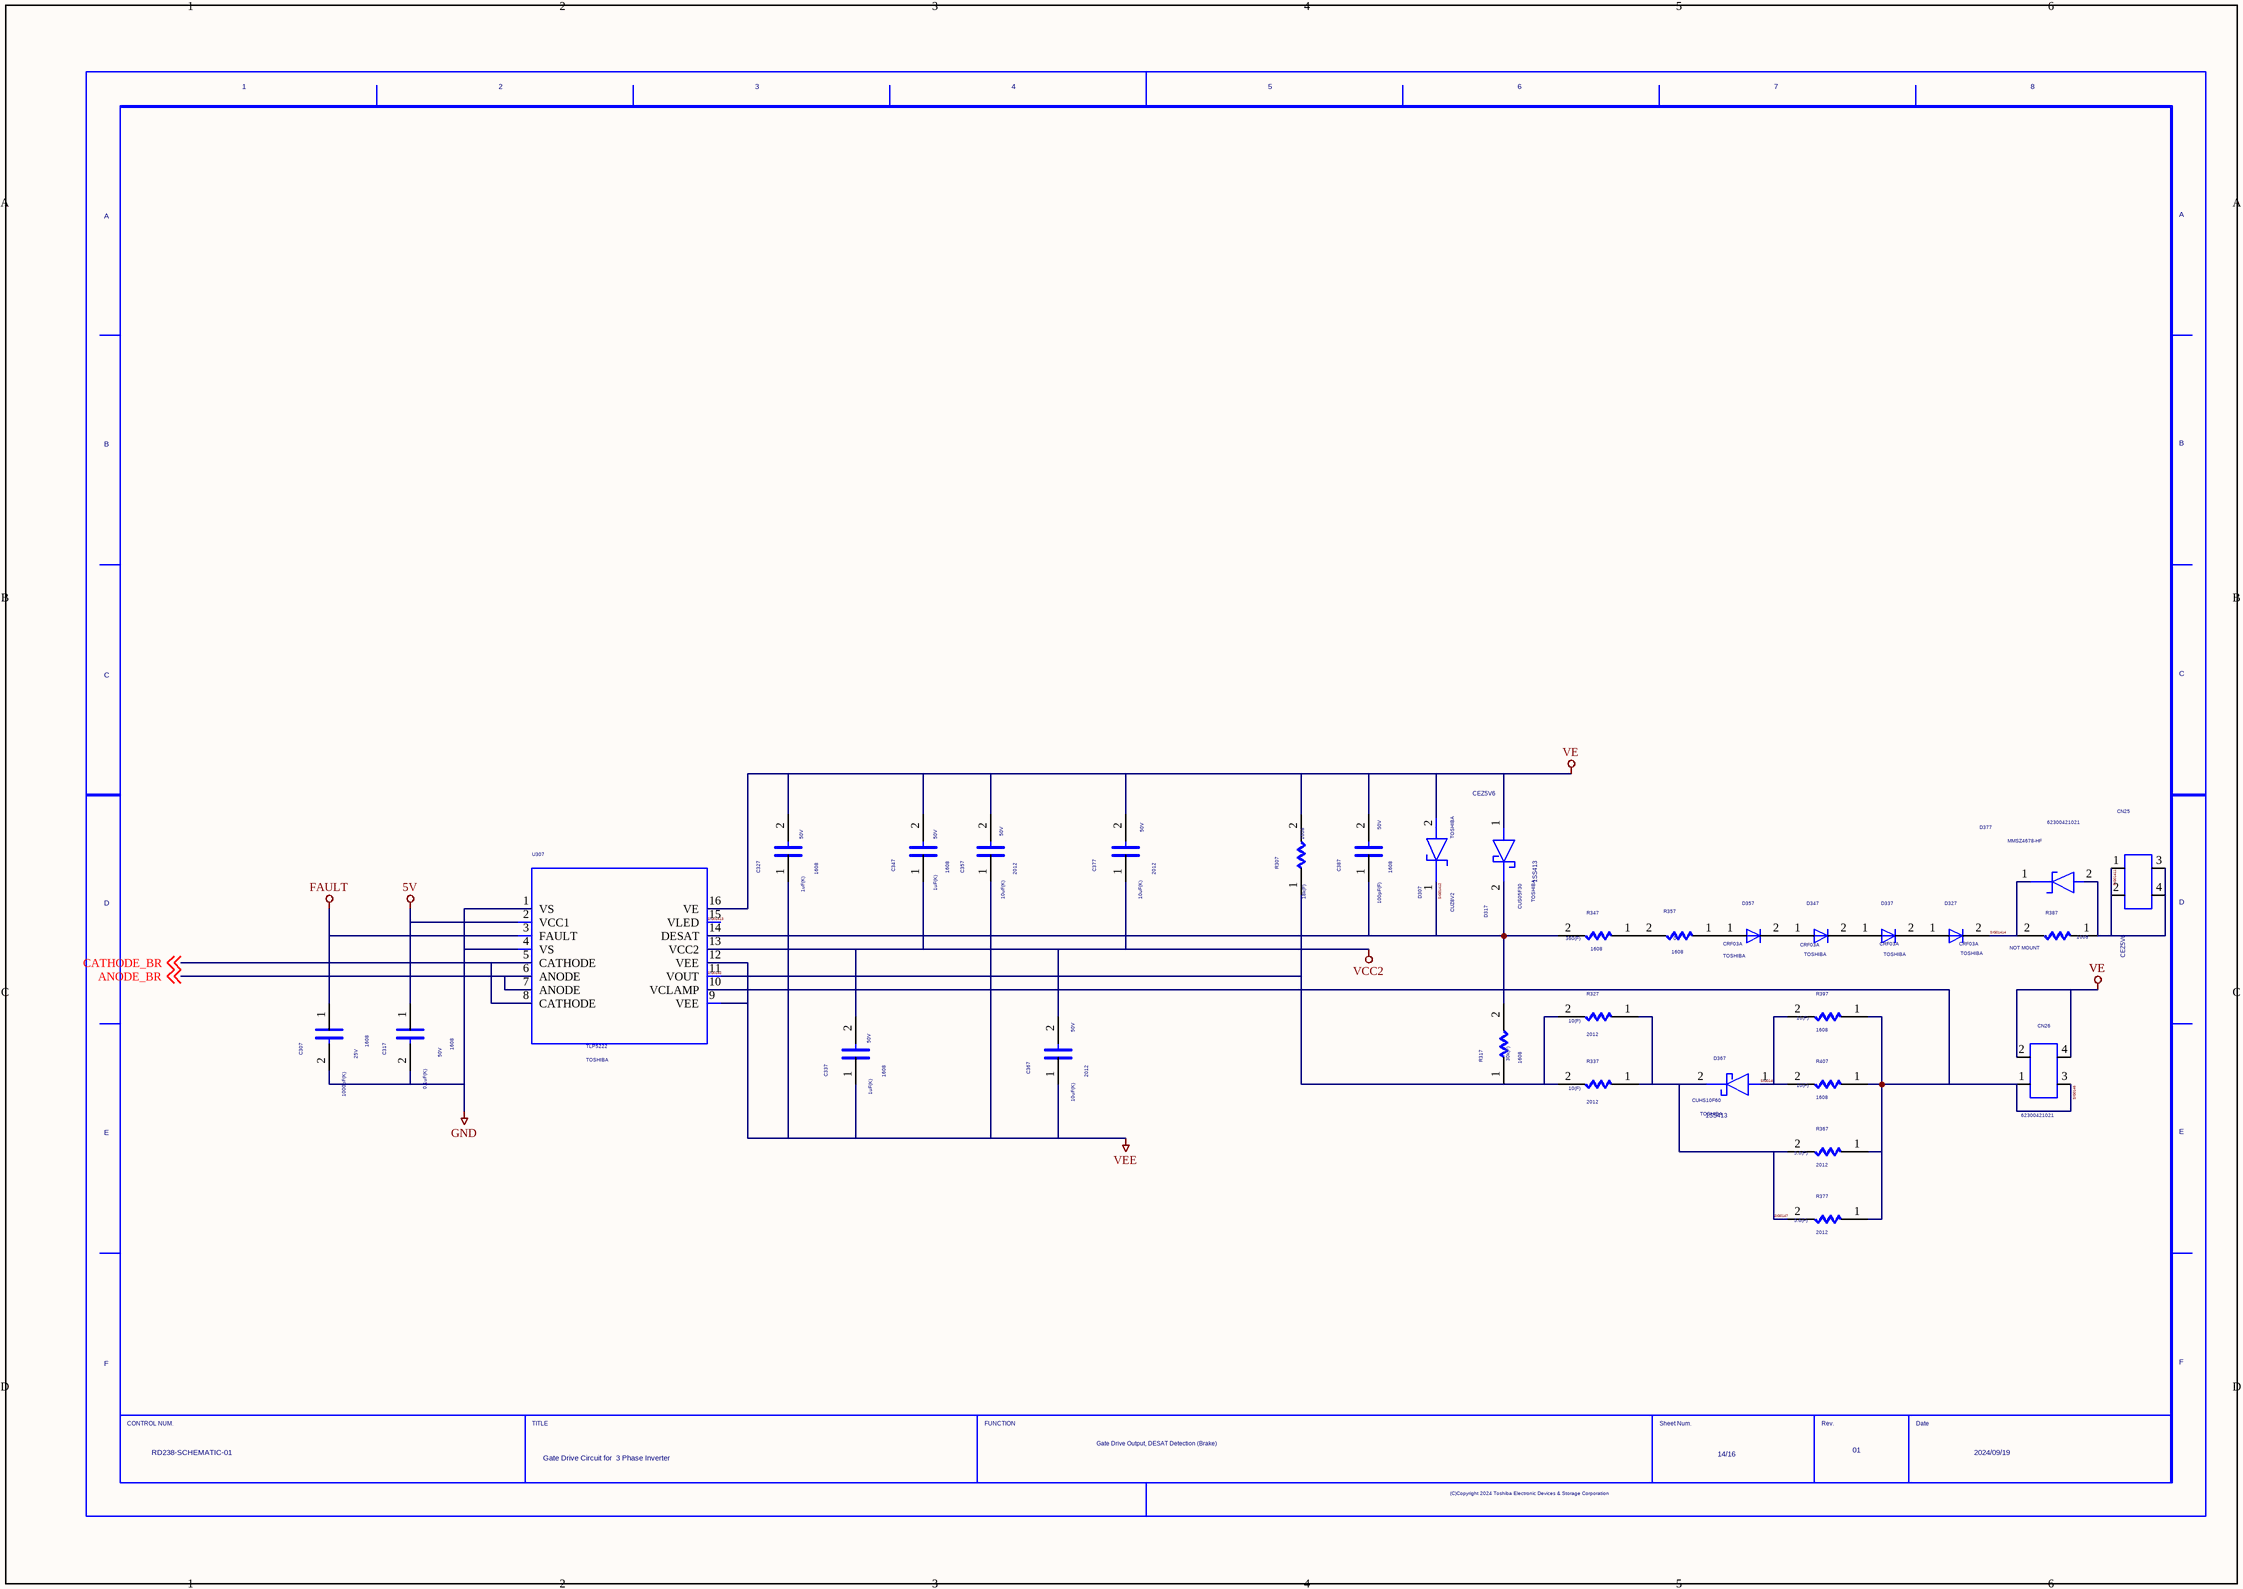
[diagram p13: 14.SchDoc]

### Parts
(Parts that share a designator on the sheet are numbered #1, #2 ... from top to bottom, then left to right.)
C307  VAL1: 1000pF(K)  VAL2: 25V  SIZECODESMD: 1608  (hidden comment: C)
C317  VAL1: 0.1uF(K)  VAL2: 50V  SIZECODESMD: 1608  (hidden comment: C)
C327  VAL1: 1uF(K)  VAL2: 50V  SIZECODESMD: 1608  (hidden comment: C)
C337  VAL1: 1uF(K)  VAL2: 50V  SIZECODESMD: 1608  (hidden comment: C)
C347  VAL1: 1uF(K)  VAL2: 50V  SIZECODESMD: 1608  (hidden comment: C)
C357  VAL1: 10uF(K)  VAL2: 50V  SIZECODESMD: 2012  (hidden comment: C)
C367  VAL1: 10uF(K)  VAL2: 50V  SIZECODESMD: 2012  (hidden comment: C)
C377  VAL1: 10uF(K)  VAL2: 50V  SIZECODESMD: 2012  (hidden comment: C)
C387  VAL1: 100pF(F)  VAL2: 50V  SIZECODESMD: 1608  (hidden comment: C)
CN25  VAL3: 62300421021  (hidden comment: TCR1HF50B)
CN26  VAL3: 62300421021  (hidden comment: TCR1HF50B)
D307  CEZ5V6  USERCOMPTEXT3: TOSHIBA  VAL3: CUZ8V2
D317  VAL3: CUS05F30  USERCOMPTEXT3: TOSHIBA  (hidden comment: 1SS413)
D327  USERCOMPTEXT3: TOSHIBA  VAL3: CRF03A  (hidden comment: D1)
D337  USERCOMPTEXT3: TOSHIBA  VAL3: CRF03A  (hidden comment: D1)
D347  USERCOMPTEXT3: TOSHIBA  VAL3: CRF03A  (hidden comment: D1)
D357  USERCOMPTEXT3: TOSHIBA  VAL3: CRF03A  (hidden comment: D1)
D367  USERCOMPTEXT3: TOSHIBA  VAL3: CUHS10F60  (hidden comment: 1SS413)
D377  CEZ5V6  VAL3: MMSZ4678-HF
R307  VAL1: 18k(F)  SIZECODESMD: 1608  (hidden comment: R)
R317  VAL1: 30k(F)  SIZECODESMD: 1608  (hidden comment: R)
R327  VAL1: 10(F)  SIZECODESMD: 2012  (hidden comment: R)
R337  VAL1: 10(F)  SIZECODESMD: 2012  (hidden comment: R)
R347  VAL1: 360(F)  SIZECODESMD: 1608  (hidden comment: R)
R357  VAL1: 0  SIZECODESMD: 1608  (hidden comment: R)
R367  VAL1: 5.6(F)  SIZECODESMD: 2012  (hidden comment: R)
R377  VAL1: 5.6(F)  SIZECODESMD: 2012  (hidden comment: R)
R387  NOTMOUNT: NOT MOUNT  VAL1: 0  SIZECODESMD: 1608  (hidden comment: R)
R397  VAL1: 10(F)  SIZECODESMD: 1608  (hidden comment: R)
R407  VAL1: 10(F)  SIZECODESMD: 1608  (hidden comment: R)
U307  USERCOMPTEXT3: TOSHIBA  (hidden comment: TLP5231)
U?#14  DATE: 2024/09/19  DRAWINGNUMBER: RD238-SCHEMATIC-01  TITLE: Gate Drive Circuit for / 3 Phase Inverter  FUNCTION: Gate Drive Output, DESAT Detection / (Brake)  SHEETNUMBER: 14/16  REVISION: 01  (hidden comment: WAKU_DEF100)

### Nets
5V: C317.1 U307.2(VCC1)
FAULT: C307.1 U307.3(FAULT)
GND: C307.2 C317.2 U307.1(VS) U307.4(VS)
VCC2: C337.2 C347.1 C367.2 C377.1 U307.13(VCC2)
VE: C327.2 C347.2 C357.2 C377.2 C387.2 CN26.2 CN26.4 D307.2(ANODE) D317.1(ANODE) R307.2 U307.16(VE)
VEE: C327.1 C337.1 C357.1 C367.1 U307.9(VEE) U307.12(VEE)
ANODE_BR: U307.6(ANODE) U307.7(ANODE) ; off-sheet ANODE_BR
CATHODE_BR: U307.5(CATHODE) U307.8(CATHODE) ; off-sheet CATHODE_BR
SIG0142: R307.1 R317.1 R327.2 R337.2 U307.11(VOUT)
SIG0145: D367.1(ANODE) R397.2 R407.2
SIG0146: CN26.1 CN26.3 R367.1 R377.1 R397.1 R407.1 U307.10(VCLAMP)
SIG0147: D367.2(CATHODE) R327.1 R337.1 R367.2 R377.2
SIG01411: CN25.1 CN25.2 CN25.3 CN25.4 D377.2(ANODE) R387.1
SIG01412: C387.1 D307.1(CATHODE) D317.2(CATHODE) R317.2 R347.2 U307.14(DESAT)
SIG01413: U307.15(VLED)
SIG01414: D327.2 D377.1(CATHODE) R387.2
NetD327_1: D327.1 D337.2
NetD337_1: D337.1 D347.2
NetD347_1: D347.1 D357.2
NetD357_1: D357.1 R357.1
NetR347_1: R347.1 R357.2

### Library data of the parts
C307 C317 C327 C337 C347 C357 C367 C377 C387 = C: OriginalSymbolOrigin: (2540,7620)
CN25 = NTC: MANUFACTURER: toshiba; ORDER: $pOrder; 特性1: 36 V; 特性2: 150mA; DESCRIPTION-A: LDO; TIME: 08:52:33; UPDATEUSER: sptcae09; UPDATETIME: 07:55:13; SAVECOUNT: 8; COMPONENTNAME: LT8306; OriginalSymbolOrigin: (5080,12700); COMP: DESAT_BR
CN26 = NTC: MANUFACTURER: toshiba; ORDER: $pOrder; 特性1: 36 V; 特性2: 150mA; DESCRIPTION-A: LDO; TIME: 08:52:33; UPDATEUSER: sptcae09; UPDATETIME: 07:55:13; SAVECOUNT: 8; COMPONENTNAME: LT8306; OriginalSymbolOrigin: (5080,12700); COMP: GS_BR
D307 = CEZ5V6_D500: as D10 on sheet 1
D317 D367 = 1SS413_D501: as D311 on sheet 8
D327 D337 D347 D357 = D1: as D321 on sheet 8
D377 = CEZ5V6_D500: as D371 on sheet 8
R307 R317 = R: as R301 on sheet 8
R327 R337 R367 R377 R397 R407 = R: as R321 on sheet 8
R347 = R: as R341 on sheet 8
R357 R387 = R: as R10 on sheet 1
U307 = TLP5222: as U301 on sheet 8
U?#14 = WAKU_DEF100: SAVEAREA0: 185750,-43960,448537,75779; TIME: 14:30:25; UPDATEUSER: t5459927; UPDATETIME: 13:49:47; SAVECOUNT: 9; OriginalSymbolOrigin: (10160,284480); COMP: VCC1; SHTSAVECOUNT: 31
